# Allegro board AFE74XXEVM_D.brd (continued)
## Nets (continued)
CIN1: C155.2 L12.2 T12.3(PRI DOT)
CIN1M: C147.1 U1.Y16(RXCDSA1M)
CIN1P: C146.1 U1.Y17(RXCDSA1P)
CIN2: C487.2 L59.2 T14.3(PRI DOT)
CIN2M: C491.1 U1.Y13(RXCDSA2M)
CIN2P: C490.1 U1.Y14(RXCDSA2P)
CLK0_M2C_N: C423.2 J32.H5
CLK0_M2C_P: C424.2 J32.H4
CLK1_M2C_N: C425.2 J32.G3
CLK1_M2C_P: C426.2 J32.G2
CLK-IN: R159.1 R161.2 R165.1 T24.6(PRIMARY_DOT)
CLK_LAO_0M: J32.G7 R191.2
CLK_LAO_0P: J32.G6 R189.2
CLK_N: L2.1 R295.1 R323.1 U1.L19(CLKM)
CLK_P: L1.1 R295.2 R322.1 U1.K19(CLKP)
CLKIN1_N: C230.2 C231.2 L43.2
CLKIN1_P: C227.2 L44.2
CLKIN1N: C239.2 L43.1 U3.35(CLKIN1N/FBCLKINN/FINN)
CLKIN1P: C238.2 L44.1 U3.34(CLKIN1P/FBCLKINP/FINP)
CLKINN: C231.1 R166.2 T24.3(SECONDARY)
CLKINP: C227.1 R157.1 R159.2 R166.1 T24.1(SECONDARY_DOT)
CLKLA_0M: R191.1 R192.1 U3.63(DCLKOUT12N)
CLKLA_0P: R189.1 R190.1 U3.62(DCLKOUT12P)
CLKN: C228.2 L2.2
CLKP: C229.2 L1.2
CNTR_TAP_CHA: C187.1 C188.2 C190.1 C191.1 L29.2 T20.5(SECONDARY_CT)
CNTR_TAP_CHB: C193.1 C194.1 C199.1 C200.2 L31.2 T21.5(SECONDARY_CT)
CNTR_TAP_CHC: C206.1 C207.2 C209.1 C210.1 L37.2 T22.5(SECONDARY_CT)
CNTR_TAP_CHD: C212.1 C213.1 C218.1 C219.2 L39.2 T23.5(SECONDARY_CT)
CP1: C222.1 C223.1 R152.2 U3.32(CPOUT1) Y1.1(VC)
CP2: C225.1 C226.1 U3.46(CPOUT2)
D_IN1: J20.1(CENTER) R115.1 R118.2
D_IN2: J21.1(CENTER) R345.2 R347.1
DAC_ALT_SYNC_N: J32.F20 U1.P10(SYNCBOUTM1)
DAC_ALT_SYNC_P: J32.F19 U1.P11(SYNCBOUTP1)
DAC_SYNC_N: J32.F11 U1.G10(SYNCBOUTM0)
DAC_SYNC_P: J32.F10 U1.G11(SYNCBOUTP0)
DACCLK_IN: C4.1 J1.1(CENTER)
DACOUT: R21.2 R321.2
DCLKOUT4N: C254.1 R188.1 U3.25(DCLKOUT4N)
DCLKOUT4P: C253.1 R187.1 U3.24(DCLKOUT4P)
DCLKOUT6N: C424.1 R289.1 U3.28(DCLKOUT6N)
DCLKOUT6P: C423.1 R290.1 U3.27(DCLKOUT6P)
DCLKOUT10N: C428.1 R293.1 U3.55(DCLKOUT10N)
DCLKOUT10P: C427.1 R294.1 U3.54(DCLKOUT10P)
DIN1: C148.2 L16.2 T16.3(PRI DOT)
DIN1M: C154.1 U1.Y10(RXDDSA1M)
DIN1P: C153.1 U1.Y11(RXDDSA1P)
DIN2: C495.2 L63.2 T18.3(PRI DOT)
DIN2M: C498.1 U1.Y7(RXDDSA2M)
DIN2P: C499.1 U1.Y8(RXDDSA2P)
DIV_IN: C1.2 U2.2(CLK)
DM: J33.2(D-) R211.1
DP: J33.3(D+) R212.1
DP0_C2M_N: C37.1 J32.C3
DP0_C2M_P: C39.1 J32.C2
DP0_M2C_N: C35.1 J32.C7
DP0_M2C_P: C36.1 J32.C6
DP1_C2M_N: C33.1 J32.A23
DP1_C2M_P: C34.1 J32.A22
DP1_M2C_N: C38.1 J32.A3
DP1_M2C_P: C40.1 J32.A2
DP2_C2M_N: C31.1 J32.A27
DP2_C2M_P: C29.1 J32.A26
DP2_M2C_N: C32.1 J32.A7
DP2_M2C_P: C30.1 J32.A6
DP3_C2M_N: C26.1 J32.A31
DP3_C2M_P: C25.1 J32.A30
DP3_M2C_N: C27.1 J32.A11
DP3_M2C_P: C28.1 J32.A10
DP4_C2M_N: C19.1 J32.A35
DP4_C2M_P: C17.1 J32.A34
DP4_M2C_N: C20.1 J32.A15
DP4_M2C_P: C18.1 J32.A14
DP5_C2M_N: C10.1 J32.A39
DP5_C2M_P: C9.1 J32.A38
DP5_M2C_N: C13.1 J32.A19
DP5_M2C_P: C14.1 J32.A18
DP6_C2M_N: C11.1 J32.B37
DP6_C2M_P: C12.1 J32.B36
DP6_M2C_N: C15.1 J32.B17
DP6_M2C_P: C16.1 J32.B16
DP7_C2M_N: C23.1 J32.B33
DP7_C2M_P: C21.1 J32.B32
DP7_M2C_N: C24.1 J32.B13
DP7_M2C_P: C22.1 J32.B12
EE_ADDR0_RX: J32.C34 U31.1(A0)
EE_ADDR1_RX: J32.D35 U31.2(A1)
EEDATA: R220.1 U5.61(EEDATA) U8.3(DI)
FBBANDSEL1: J9.50 U1.H9(FBBANDSEL1)
FBBANDSEL2: J9.53 U1.N9(FBBANDSEL2)
FMC_FBBANDSEL1: J9.51
FMC_FBBANDSEL2: J9.54
FMC_FSPICLKA: J32.J6 R40.2
FMC_FSPICLKB: J32.J7 R42.2
FMC_FSPICLKC: J32.J9 R44.2
FMC_FSPICLKD: J32.J10 R46.2
FMC_FSPIDA: J32.J12 R41.2
FMC_FSPIDB: J32.J13 R43.2
FMC_FSPIDC: J32.J15 R45.2
FMC_FSPIDD: J32.J16 R47.2
FMC_LMK_CS: J32.H17 U33.5(A4)
FMC_LMK_SCK: J32.G15 U33.2(A1)
FMC_LMK_SDIO: J32.G16 U33.3(A2)
FMC_LMK_SDO: J32.H16 U33.4(A3)
FMC_RXADSA1PD: J7.9 J32.K7
FMC_RXADSA2PD: J7.12 J32.K8
FMC_RXADSAFAST: J9.3 J32.G18
FMC_RXAPD2H: J7.33 J32.K10
FMC_RXAPD2L: J7.36 J32.K11
FMC_RXBDSA1PD: J7.15 J32.K13
FMC_RXBDSA2PD: J7.18 J32.K14
FMC_RXBDSAFAST: J9.6 J32.G21
FMC_RXBPD2H: J7.39 J32.J18
FMC_RXBPD2L: J7.42 J32.J19
FMC_RXCDSA1PD: J7.21
FMC_RXCDSA2PD: J7.24
FMC_RXCDSAFAST: J9.9
FMC_RXDDSA1PD: J7.27
FMC_RXDDSA2PD: J7.30
FMC_RXDDSAFAST: J9.12
FMC_RXDSASW: J9.48 J32.F13
FMC_RXFBNCO0: J9.15
FMC_RXFBNCO1: J9.18
FMC_RXFBNCO2: J9.21
FMC_RXFBNCO3: J9.24
FMC_RXFBSW1: J9.39
FMC_RXFBSW2: J9.42
FMC_RXTDD1: J9.33
FMC_RXTDD2: J9.36
FMC_SCL: J32.C30 J37.2 U31.6(SCL)
FMC_SDA: J32.C31 J37.1 U31.5(SDA)
FMC_SPIACLK: J13.6 J32.D11
FMC_SPIASDIO: J13.12 J32.D12
FMC_SPIASDO: J13.9 J32.D26
FMC_SPIASEN: J13.3 J32.D27
FMC_SPIBCLK: J13.18 J32.E12
FMC_SPIBSDIO: J13.24 J32.E13
FMC_SPIBSDO: J13.21 J32.E15
FMC_SPIBSEN: J13.15 J32.E16
FMC_TCK: J10.3 J32.D29
FMC_TDI: J10.6 J32.D30
FMC_TDO: J10.9 J32.D31
FMC_TMS: J10.12 J32.D33
FMC_TRSTB: J10.15 J32.D34
FMC_TXDSASW: J9.45 J32.F14
FMC_TXTDD1: J9.27 J32.F16
FMC_TXTDD2: J9.30 J32.F17
FPGA_CLK1_N: C241.2 J32.K5
FPGA_CLK1_P: C240.2 J32.K4
FPGA_CLK1N: C241.1 R177.1 U3.52(DCLKOUT8N)
FPGA_CLK1P: C240.1 R176.1 U3.51(DCLKOUT8P)
FPGA_CLK2_N: C250.2 J32.J3
FPGA_CLK2_P: C249.2 J32.J2
FPGA_CLK2N: C250.1 R182.1 U3.50(SDCLKOUT9N)
FPGA_CLK2P: C249.1 R183.1 U3.49(SDCLKOUT9P)
FSPICLKA: R33.2 R40.1 U1.C11(FSPICLKA)
FSPICLKB: R35.2 R42.1 U1.C14(FSPICLKB)
FSPICLKC: R36.2 R44.1 U1.V11(FSPICLKC)
FSPICLKD: R39.2 R46.1 U1.V14(FSPICLKD)
FSPIDA: R32.2 R41.1 U1.C10(FSPIDA)
FSPIDB: R34.2 R43.1 U1.C13(FSPIDB)
FSPIDC: R37.2 R45.1 U1.V10(FSPIDC)
FSPIDD: R38.2 R47.1 U1.V13(FSPIDD)
FTDI_DSASW: C45.2 J9.43 J9.46 JP7.1 R24.1 U10.4(A3)
FTDI_FBBANDSEL: C46.2 J9.49 J9.52 JP8.1 R25.1 U10.5(A4)
FTDI_FSPICLKA: J12.2 U6.1(A1)
FTDI_FSPICLKB: J12.6 U6.4(A3)
FTDI_FSPICLKC: J12.10 U6.6(A5)
FTDI_FSPICLKD: J12.14 U6.8(A7)
FTDI_FSPIDA: J12.4 U6.3(A2)
FTDI_FSPIDB: J12.8 U6.5(A4)
FTDI_FSPIDC: J12.12 U6.7(A6)
FTDI_FSPIDD: J12.16 U6.9(A8)
FTDI_RXDSAFAST: C42.2 J9.1 J9.4 J9.7 J9.10 JP2.1 R27.1 U10.2(A1)
FTDI_RXFBNCO: C47.2 J9.13 J9.16 J9.19 J9.22 JP3.1 R28.1 U10.3(A2)
FTDI_RXFBSW: C44.2 J9.37 J9.40 JP6.1 R23.1 U9.9(A8)
FTDI_RXTDD_MODE: C43.2 J9.31 J9.34 JP5.1 R22.1 U9.8(A7)
FTDI_SPIACLK: J13.4 U7.3(A2)
FTDI_SPIASDIO: J13.10 U7.5(A4)
FTDI_SPIASDO: J13.7 U7.4(A3)
FTDI_SPIASEN: J13.1 U7.1(A1)
FTDI_SPIBCLK: J13.16 U7.7(A6)
FTDI_SPIBSDIO: J13.22 U7.9(A8)
FTDI_SPIBSDO: J13.19 U7.8(A7)
FTDI_SPIBSEN: J13.13 U7.6(A5)
FTDI_TCK: J10.1 U9.1(A1)
FTDI_TDI: J10.4 U9.3(A2)
FTDI_TDO: J10.7 U9.4(A3)
FTDI_TMS: J10.10 U9.5(A4)
FTDI_TRSTB: J10.13 U9.6(A5)
FTDI_TXTDD_MODE: C48.2 J9.25 J9.28 JP4.1 R29.1 U9.7(A6)
GBTCLK1_M2C_N: C428.2 J32.B21
GBTCLK1_M2C_P: C427.2 J32.B20
GTX_CLKM: C224.2 J32.D5
GTX_CLKP: C221.2 J32.D4
GTXCLKM: C224.1 R154.1 U3.2(DCLKOUT0N)
GTXCLKP: C221.1 R155.1 U3.1(DCLKOUT0P)
IOUTA: J22.1(CENTER) R136.1 R139.1
IOUTB: J23.1(CENTER) R140.1 R143.1
IOUTC: J24.1(CENTER) R144.1 R147.1
IOUTD: J25.1(CENTER) R148.1 R151.1
LMK LOCKED: D6.1(ANODE) R199.1
LMK_CLKIN: J26.1(CENTER) R161.1 R164.1
LMK_CS: J36.11 U3.18(\\C\S\)
LMK_SCK: J36.2 U3.19(SCK)
LMK_SDIO: J36.5 U3.20(SDIO)
LMK_SDO: J36.8 R195.2 U3.5(RESET)
NB7_RESET: R205.2 U2.15(R)
OSCI: C296.1 U5.2(OSCI) Y2.1
OSCINN: C252.2 C255.2 U3.44(OSCINN)
OSCINP: C245.2 C247.2 U3.43(OSCINP)
OSCO: C298.1 U5.3(OSCO) Y2.3
OSCP: C244.2 C245.1 R175.2 R180.1
PG_2P2V: Q27.1(B) R273.2 R328.1 U18.5(PG)
PG_C2M: J32.D1 R287.1
PG_DVDD1P0V: R251.2 R326.1 U16.22(PG) U27.4(PG)
PG_M2C: J32.F1 R286.2
PG_RX1P2V: R257.2 R279.2 R325.1 U23.4(PG)
PG_RX1P85V: Q25.2(G1) R327.2 U25.4(PG)
PG_TX1P0V: R261.2 R324.1 U20.4(PG)
PG_TX1P8V: R267.2 R308.2 U22.4(PG) U29.4(PG)
PLL2 LOCKED: D7.1(ANODE) R200.1
PLL_CLKLD: J8.3 Q2.1(B)
PLL_REFLD: J8.1 Q1.1(B)
PLLCLKLD: J8.4 U1.T16(PLLCLKLD)
PLLREFLD: J8.2 U1.E16(PLLREFLD)
PRESENT: J32.H2 R288.1
RX1N: C9.2 U1.A2(SRX1M)
RX1P: C10.2 U1.A3(SRX1P)
RX2N: C12.2 U1.C1(SRX2M)
RX2P: C11.2 U1.B1(SRX2P)
RX3N: C17.2 U1.F1(SRX3M)
RX3P: C19.2 U1.E1(SRX3P)
RX4N: C21.2 U1.J1(SRX4M)
RX4P: C23.2 U1.H1(SRX4P)
RX5N: C26.2 U1.M1(SRX5M)
RX5P: C25.2 U1.N1(SRX5P)
RX6N: C31.2 U1.R1(SRX6M)
RX6P: C29.2 U1.T1(SRX6P)
RX7N: C33.2 U1.V1(SRX7M)
RX7P: C34.2 U1.W1(SRX7P)
RX8N: C37.2 U1.Y2(SRX8M)
RX8P: C39.2 U1.Y3(SRX8P)
RX_1.2V: C81.1 C82.1 C83.1 C84.1 C85.1 C86.1 C87.1 C88.1 C89.1 C90.1 C388.1 C389.1 FB32.3 PP20.1 U1.F5(RX1P2V#F5) U1.F6(RX1P2V#F6) U1.F7(RX1P2V#F7) U1.F8(RX1P2V#F8) U1.F9(RX1P2V#F9) U1.F10(RX1P2V#F10) U1.G6(RX1P2V#G6) U1.G7(RX1P2V#G7) U1.G8(RX1P2V#G8) U1.P6(RX1P2V#P6) U1.P7(RX1P2V#P7) U1.P8(RX1P2V#P8) U1.R5(RX1P2V#R5) U1.R6(RX1P2V#R6) U1.R7(RX1P2V#R7) U1.R8(RX1P2V#R8) U1.R9(RX1P2V#R9) U1.R10(RX1P2V#R10)
RX_1.8V: C66.1 C67.1 C68.1 C69.1 C70.1 C71.1 C72.1 C73.1 C74.1 C75.1 C394.1 C395.1 FB33.3 PP22.1 U1.C5(RX1P8V#C5) U1.C6(RX1P8V#C6) U1.D5(RX1P8V#D5) U1.D6(RX1P8V#D6) U1.D9(RX1P8V#D9) U1.D10(RX1P8V#D10) U1.E5(RX1P8V#E5) U1.E6(RX1P8V#E6) U1.E9(RX1P8V#E9) U1.E10(RX1P8V#E10) U1.T5(RX1P8V#T5) U1.T6(RX1P8V#T6) U1.T9(RX1P8V#T9) U1.T10(RX1P8V#T10) U1.U5(RX1P8V#U5) U1.U6(RX1P8V#U6) U1.U9(RX1P8V#U9) U1.U10(RX1P8V#U10) U1.V5(RX1P8V#V5) U1.V6(RX1P8V#V6)
RXA_DSA1PD: J7.7 Q5.1(B)
RXA_DSA2PD: J7.10 Q6.1(B)
RXA_PD2H: J7.31 Q13.1(B)
RXA_PD2L: J7.34 Q14.1(B)
RXADSA1PD: J7.8 R302.1
RXADSA2PD: J7.11 R303.1
RXADSAFAST: J9.2 U1.E14(RXADSAFAST)
RXAPD2H: J7.32 R315.1
RXAPD2L: J7.35 R316.1
RXB_DSA1PD: J7.13 Q7.1(B)
RXB_DSA2PD: J7.16 Q8.1(B)
RXB_PD2H: J7.37 Q15.1(B)
RXB_PD2L: J7.40 Q16.1(B)
RXBDSA1PD: J7.14 R309.1
RXBDSA2PD: J7.17 R310.1
RXBDSAFAST: J9.5 U1.F11(RXBDSAFAST)
RXBPD2H: J7.38 R317.1
RXBPD2L: J7.41 R318.1
RXC_DSA1PD: J7.19 Q9.1(B)
RXC_DSA2PD: J7.22 Q10.1(B)
RXC_PD2H: J7.43 Q17.1(B)
RXC_PD2L: J7.46 Q18.1(B)
RXCDSA1PD: J7.20 R311.1
RXCDSA2PD: J7.23 R312.1
RXCDSAFAST: J9.8 U1.T14(RXCDSAFAST)
RXCPD2H: J7.44 R319.1
RXCPD2L: J7.47 R320.1
RXD_DSA1PD: J7.25 Q11.1(B)
RXD_DSA2PD: J7.28 Q12.1(B)
RXD_PD2H: J7.49 Q19.1(B)
RXD_PD2L: J7.52 Q20.1(B)
RXDDSA1PD: J7.26 R313.1
RXDDSA2PD: J7.29 R314.1
RXDDSAFAST: J9.11 U1.R11(RXDDSAFAST)
RXDPD2H: J7.50 R304.1
RXDPD2L: J7.53 R305.1
RXDSASW: J9.47 U1.D13(RXDSASW)
RXFBNCO0: J9.14 U1.C12(RXFBNCO0)
RXFBNCO1: J9.17 U1.G9(RXFBNCO1)
RXFBNCO2: J9.20 U1.V12(RXFBNCO2)
RXFBNCO3: J9.23 U1.P9(RXFBNCO3)
RXFBSW1: J9.38 U1.E11(RXFBSW1)
RXFBSW2: J9.41 U1.T11(RXFBSW2)
RXTDD1: J9.32 U1.D7(RXTDD1)
RXTDD2: J9.35 U1.U7(RXTDD2)
SDCLKOUT5N: C257.1 R194.1 U3.23(SDCLKOUT5N)
SDCLKOUT5P: C256.1 R193.1 U3.22(SDCLKOUT5P)
SDCLKOUT7N: C426.1 R291.1 U3.30(SDCLKOUT7N)
SDCLKOUT7P: C425.1 R292.1 U3.29(SDCLKOUT7P)
SLEEPMODE: J9.62 U1.P5(SLEEPMODE)
SPIACLK: J13.5 U1.D14(SPIACLK)
SPIASDIO: J13.11 U1.E15(SPIASDIO)
SPIASDO: J13.8 U1.C15(SPIASDO)
SPIASEN: J13.2 U1.D15(SPIASEN)
SPIBCLK: J13.17 U1.U14(SPIBCLK)
SPIBSDIO: J13.23 U1.T15(SPIBSDIO)
SPIBSDO: J13.20 U1.V15(SPIBSDO)
SPIBSEN: J13.14 U1.U15(SPIBSEN)
STAT 0: D4.1(ANODE) R197.1
STAT 1: D5.1(ANODE) R198.1
SYNC: R196.2 U3.6(SYNC)
SYNCB0CMOS: J32.E6 U1.E13(SYNCB0CMOS)
SYNCB1CMOS: J32.E7 U1.C8(SYNCB1CMOS)
SYNCB2CMOS: J32.E9 U1.T13(SYNCB2CMOS)
SYNCB3CMOS: J32.E10 U1.V8(SYNCB3CMOS)
SYSREF+: R172.1 R174.1 U3.14(SDCLKOUT3N)
SYSREF-: R169.1 R173.1 U3.13(SDCLKOUT3P)
SYSREF-N: R13.2 R14.1 R296.1 U1.L14(SYSREFM)
SYSREF-P: R11.1 R12.2 R296.2 U1.K14(SYSREFP)
SYSREFN: R13.1 R15.2 R169.2
SYSREFP: R12.1 R16.2 R172.2
TCLK: J10.2 U1.K5(TCLK)
TDI: J10.5 U1.L5(TDI)
TDO: J10.8 U1.H5(TDO)
TMS: J10.11 U1.N5(TMS)
TRST: J10.14 R30.1 U1.M5(TRST)
TX1ENB: J9.56 U1.D16(TXENB1)
TX1N: C14.2 U1.C3(STX1M)
TX1P: C13.2 U1.C4(STX1P)
TX2ENB: J9.59 U1.U16(TXENB2)
TX2N: C16.2 U1.E3(STX2M)
TX2P: C15.2 U1.E4(STX2P)
TX3N: C18.2 U1.G3(STX3M)
TX3P: C20.2 U1.G4(STX3P)
TX4N: C22.2 U1.J3(STX4M)
TX4P: C24.2 U1.J4(STX4P)
TX5N: C27.2 U1.M3(STX5M)
TX5P: C28.2 U1.M4(STX5P)
TX6N: C32.2 U1.P3(STX6M)
TX6P: C30.2 U1.P4(STX6P)
TX7N: C35.2 U1.T3(STX7M)
TX7P: C36.2 U1.T4(STX7P)
TX8N: C38.2 U1.V3(STX8M)
TX8P: C40.2 U1.V4(STX8P)
TXAM: L27.1 R137.2 T20.4(SECONDARY_DOT) U1.C20(TXAM)
TXAP: L28.2 R137.1 T20.6(SECONDARY) U1.B20(TXAP)
TXBM: L34.2 R141.1 T21.6(SECONDARY) U1.F20(TXBM)
TXBP: L33.1 R141.2 T21.4(SECONDARY_DOT) U1.G20(TXBP)
TXCM: L35.1 R145.2 T22.4(SECONDARY_DOT) U1.W20(TXCP)
TXCP: L36.2 R145.1 T22.6(SECONDARY) U1.V20(TXCM)
TXDM: L42.2 R149.1 T23.6(SECONDARY) U1.P20(TXDP)
TXDP: L41.1 R149.2 T23.4(SECONDARY_DOT) U1.R20(TXDM)
TXDSASW: J9.44 U1.U13(TXDSASW)
TXTDD1: J9.26 U1.C16(TXTDD1)
TXTDD2: J9.29 U1.V16(TXTDD2)
U16_FB: C340.2 R237.2 R239.2 R243.1 R245.2 R321.1 U16.2(FB)
U16_SW: C327.1 L46.1 R236.2 U16.6(SW1) U16.7(SW2) U16.8(SW3) U16.9(SW4) U16.10(SW5) U16.11(SW6)
USB_DM: C291.1 R211.2 U5.7(DM)
USB_DP: C290.1 R212.2 U5.8(DP)
USB_EECLK: R218.1 U5.62(EECLK) U8.2(CLK)
USB_EECS: R217.1 U5.63(EECS) U8.1(CS)
USB_REF: R214.1 U5.6(REF)
USB_RST: R215.2 U5.14(RESET)
VADJ: J32.E39 J32.F40 J32.G39 J32.H40 R286.1
VIO_B_M2C: J32.J39 J32.K40 TP3.1(TP)
VREF_A_M2C: J32.H1 TP4.1(TP)
VREF_B_M2C: J32.K1 TP5.1(TP)
Y2_N: R184.1 R185.1 Y1.4(OUT_N)
Y2_P: R178.1 R179.1 Y1.5(OUT_P)
YO2_N: C251.1 R184.2
YO2_P: C244.1 R178.2
N16791764: J33.1(VBUS) R210.2
N16791900: C282.1 C283.1 FB14.2 FB15.2 U5.4(VPHY)
N16791904: C271.1 C272.1 FB12.2 U5.9(VPLL)
N16792068: R213.2 R215.1 R216.2
N16792392: R219.1 R220.2 U8.4(DO)
N16935212: U5.21(ADBUS4) U6.15(B5)
N16935240: U5.16(ADBUS0) U6.20(B1)
N16935242: U5.18(ADBUS2) U6.17(B3)
N17033323: FB15.1 R209.1
N17033325: D11.1(ANODE) R209.2
N17828171: C280.1 C281.1 FB13.1 U4.5(VOUT)
N17829143: R208.1 U4.3(EN)
N17906763: J31.1(CENTER) R196.1
N18051729: U5.38(CDBUS0) U9.20(B1)
N18051775: U5.39(CDBUS1) U9.18(B2)
N18051825: U5.40(CDBUS2) U9.17(B3)
N18051839: U5.41(CDBUS3) U9.16(B4)
N18199775: C251.2 C252.1 R181.2 R186.1
N18276385: C238.1 R171.2 U2.11(Q)
N18284119: C239.1 R170.2 U2.10(Q\)
N18332593: U2.1(VTCLK) U2.4(V\T\C\L\K\) U2.5(VREFAC)
N18332757: U5.23(ADBUS6) U6.13(B7)
N18476239: JP1.1 Y1.6(VDD)
N18554997: D12.1(ANODE) R221.2
N18555159: Q24.4(G) U12.4(GATE)
N18858492: R3.1 R322.2 T3.4(SEC)
N18858499: C4.2 R4.1 R7.1
N18858501: R10.1 R323.2 T3.6(SEC DOT)
N18864728: Q22.1(B) R204.2
N18864745: J32.C18 R202.1
N18864749: Q23.1(B) R206.2
N18864761: J32.D18 R206.1
N18864763: J32.D17 R204.1
N18864798: Q22.3(C) R203.2
N18864814: Q21.1(B) R202.2
N18865554: D9.2(CATHODE) R203.1
N18865572: D8.2(CATHODE) R201.1
N18865624: D10.2(CATHODE) R207.1
N18865630: J32.H19 R205.1
N18883805: C186.1 C187.2 C189.2 T20.2(PRIMARY)
N18883857: C184.2 R136.2 R138.1
N18883928: C195.2 R140.2 R142.1
N18883944: C198.2 C199.2 C201.2 T21.2(PRIMARY)
N18884373: C184.1 C185.2 T20.3(PRIMARY_DOT)
N18884375: C195.1 C197.2 T21.3(PRIMARY_DOT)
N18885333: C205.2 C206.2 C208.2 T22.2(PRIMARY)
N18885345: C202.2 R144.2 R146.1
N18885353: C214.2 R148.2 R150.1
N18885357: C217.2 C218.2 C220.2 T23.2(PRIMARY)
N18885439: C202.1 C204.2 T22.3(PRIMARY_DOT)
N18885440: C214.1 C216.2 T23.3(PRIMARY_DOT)
N18893180: C133.1 T5.6(PRI DOT)
N18962088: C309.1 C310.1 C311.1 FB17.1 U11.1(OUT1) U11.20(OUT2)
N18962090: C314.1 U11.14(NR)
N18962122: R222.2 U11.12(0P1V)
N18962132: R223.2 U11.11(0P2V)
N18962213: R224.2 U11.10(0P4V)
N18963933: R252.2 U20.5(50MV)
N18963939: C353.1 C355.1 C451.1 RS3.2 U19.3(VIN+) U20.1(OUT1) U20.19(OUT2) U20.20(OUT3)
N18963949: C362.1 U20.12(BIAS)
N18963966: R253.2 U20.6(100MV)
N18963972: C358.1 U20.3(FB)
N18963976: R254.2 U20.7(200MV)
N18964074: PP8.1 R249.1 R250.1
N18964185: R249.2 U19.1(OUT)
N18964329: C361.1 U20.13(NR/SS)
N18992157: R282.2 U29.6(100MV)
N18992183: C415.1 C418.1 C456.1 RS8.2 U29.1(OUT1) U29.19(OUT2) U29.20(OUT3) U30.3(VIN+)
N18992193: C420.1 U29.12(BIAS)
N18992197: R283.2 U29.7(200MV)
N18992199: C419.1 U29.3(FB)
N18992203: R284.2 U29.9(400MV)
N18992243: PP28.1 R280.1 R281.1
N18992297: R280.2 U30.1(OUT)
N18992349: C421.1 U29.13(NR/SS)
N18994871: R285.2 U29.10(800MV)
N19007167: C333.1 C334.1 C335.2 C336.1 L49.2 R234.2 U16.12(VIN1) U16.13(VIN2) U16.14(VIN3) U16.15(VIN4) U16.16(VIN5) U16.17(VIN6)
N19009214: C328.1 R234.1 U16.20(VDD)
N19009493: C501.1 Q26.3(C) U16.21(EN/SS)
N19010016: C327.2 R235.1
N19010394: C337.1 C447.1 C448.1 L46.2 R240.1 RS2.2 U17.3(VIN+)
N19011515: PP6.1 R238.1 R241.1
N19011541: C330.1 C449.1 C450.1 FB19.1 FB20.1 FB38.1 RS2.1 U17.4(VIN-)
N19011602: R238.2 U17.1(OUT)
N19016825: C338.2 R237.1
N19016841: C338.1 R239.1 R240.2 R301.2
N19016961: C342.2 R245.1
N19016975: C340.1 C342.1 U16.1(COMP)
N19024858: C329.2 R236.1
N19030259: R244.1 U16.18(ILIM)
N19030918: C341.1 U16.19(BP)
N19075291: R31.2 U1.V18(RBIAS)
N19075362: C49.1 U1.U18(EXTO)
N19075631: J11.1 U1.M15(ATESTTX)
N19075640: J11.3 U1.H8(VSENSE)
N19075649: J11.5 U1.N8(IFORCE)
N19075658: J11.7 U1.K2(AMUX1)
N19075667: J11.9 U1.L2(AMUX2)
N19080738: C242.2 C243.2 C246.2 C248.2 FB1.1 JP1.2
N19081029: SJP1.2(PIN2) Y1.2(NC)
N19083254: R199.2 U3.31(STATUS_LD1)
N19083268: R200.2 U3.48(STATUS_LD2)
N19083286: R198.2 U3.59(CLKIN_SEL1)
N19083328: R197.2 U3.58(CLKIN_SEL0)
N19083344: C267.1 U3.12(LDOBYP2)
N19083346: C268.1 U3.11(LDOBYP1)
N19083364: C258.2 C259.2 C260.2 FB2.2 U3.10(VCC1_VCO) U3.33(VCC5_DIG) U3.36(VCC6_PLL1)
N19083444: FB7.2 U3.39(VCC7_OSCOUT)
N19083446: FB9.2 U3.45(VCC9_CP2)
N19083508: C264.2 C265.2 C266.2 FB6.2 FB7.1 FB8.1 FB9.1 U3.47(VCC10_PLL2)
N19083566: C262.2 FB3.2 U3.21(VCC3_SYSREF)
N19083568: C261.2 FB5.2 U3.17(VCC2_CG1)
N19083616: C270.2 FB11.2 U3.64(VCC12_CG0)
N19083618: C269.2 FB10.2 U3.53(VCC11_CG3)
N19083707: C263.2 FB4.2 U3.26(VCC4_CG2)
N19086842: C229.1 R168.1 U3.16(DCLKOUT2N)
N19086844: C228.1 R167.1 U3.15(DCLKOUT2P)
N19098122: C127.2 C129.2 L3.2
N19098132: C130.2 C133.2 L3.1
N19098142: C130.1 L5.1 R58.2
N19098149: C129.1 L5.2 R48.2
N19098687: C131.2 R48.1
N19098701: C136.2 R58.1
N19189047: C253.2 J27.1(CENTER)
N19189049: C254.2 J28.1(CENTER)
N19191731: R4.2 T2.2(PRI DOT)
N19192217: C7.1 R8.2 R9.1
N19192242: C7.2 T3.2(PRI DOT)
N19192342: R8.1 T2.4(SEC)
N19192872: C1.1 R1.2 R2.1
N19192989: R1.1 T2.6(SEC DOT)
N19193468: C41.1 R17.2 SW1.2 U1.C18(RESETZ)
N19234861: FB8.2 U3.42(VCC8_OSCIN)
N19245147: C132.1 L6.2 R52.2 R54.2
N19261159: J2.1(CENTER) R3.2
N19261175: J4.1(CENTER) R10.2
N19261803: J5.1(CENTER) R11.2
N19261938: J6.1(CENTER) R14.2
N19265268: R302.2 U1.E8(RXADSA1PD)
N19265271: R303.2 U1.C9(RXADSA2PD)
N19265297: R309.2 U1.E12(RXBDSA1PD)
N19265300: R310.2 U1.D12(RXBDSA2PD)
N19265317: R311.2 U1.T8(RXCDSA1PD)
N19265320: R312.2 U1.V9(RXCDSA2PD)
N19265379: R313.2 U1.T12(RXDDSA1PD)
N19265382: R314.2 U1.U12(RXDDSA2PD)
N19265545: R315.2 U1.D8(RXAPD2H)
N19265548: R316.2 U1.D11(RXAPD2L)
N19265574: R317.2 U1.C7(RXBPD2H)
N19265577: R318.2 U1.E7(RXBPD2L)
N19265594: R319.2 U1.U8(RXCPD2H)
N19265597: R320.2 U1.U11(RXCPD2L)
N19265616: R304.2 U1.V7(RXDPD2H)
N19265619: R305.2 U1.T7(RXDPD2L)
N19270100: C256.2 J29.1(CENTER)
N19270102: C257.2 J30.1(CENTER)
N19353777: C127.1 T5.4(PRI)
N19392140: C6.2 T1.6(SECONDARY_DOT)
N19392142: C6.1 R5.1 U1.L15(CLKOUTM)
N19392187: C2.1 R5.2 U1.K15(CLKOUTP)
N19392195: C3.1 T1.3(PRIMARY_DOT)
N19392206: C3.2 J3.1(CENTER) R6.2
N19393571: R21.1 U1.G5(DACOUT)
N19402254: J36.10 U5.54(DDBUS3)
N19402263: J36.7 U5.53(DDBUS2)
N19402272: J36.4 U5.52(DDBUS1)
N19402281: J36.1 U5.48(DDBUS0)
N19403607: U5.17(ADBUS1) U6.18(B2)
N19403614: U5.19(ADBUS3) U6.16(B4)
N19403621: U5.22(ADBUS5) U6.14(B6)
N19403628: U5.24(ADBUS7) U6.12(B8)
N19407936: U5.43(CDBUS4) U9.15(B5)
N19409548: U5.26(BDBUS0) U7.20(B1)
N19409557: U5.27(BDBUS1) U7.18(B2)
N19409566: U5.28(BDBUS2) U7.17(B3)
N19409575: U5.29(BDBUS3) U7.16(B4)
N19410556: U5.30(BDBUS4) U7.15(B5)
N19410565: U5.32(BDBUS5) U7.14(B6)
N19410574: U5.33(BDBUS6) U7.13(B7)
N19410583: U5.34(BDBUS7) U7.12(B8)
N19439857: J12.1 R33.1
N19439882: J12.3 R32.1
N19439919: J12.5 R35.1
N19439930: J12.7 R34.1
N19439963: J12.9 R36.1
N19439974: J12.11 R37.1
N19440007: J12.13 R39.1
N19440018: J12.15 R38.1
N19452593: Q1.3(C) R18.2
N19452616: D1.2(CATHODE) R18.1
N19452717: Q2.3(C) R19.2
N19452732: D2.2(CATHODE) R19.1
N19463241: R251.1 U20.14(EN)
N19466012: R279.1 U29.14(EN)
N19467594: R20.1 U1.J5(SCANEN)
N19500229: Q3.3(C) Q4.3(C) Q5.3(C) Q6.3(C) Q7.3(C) Q8.3(C) Q9.3(C) Q10.3(C) Q11.3(C) Q12.3(C) Q13.3(C) Q14.3(C) Q15.3(C) Q16.3(C) Q17.3(C) Q18.3(C) Q19.3(C) Q20.3(C) R26.2
N19509945: D3.2(CATHODE) R26.1
N19512252: U5.44(CDBUS5) U9.14(B6)
N19512261: U5.45(CDBUS6) U9.13(B7)
N19512270: U5.46(CDBUS7) U9.12(B8)
N19520191: U5.55(DDBUS4) U10.10(B4)
N19520200: U5.57(DDBUS5) U10.11(B3)
N19525330: U5.59(DDBUS7) U10.13(B1)
N19525339: U5.58(DDBUS6) U10.12(B2)
N19667706: D14.1(ANODE) R287.2
N19816997: C2.2 T1.4(SECONDARY)
N19898860: J36.3 U33.13(B1)
N19898869: J36.6 U33.12(B2)
N19898878: J36.9 U33.11(B3)
N19898887: J36.12 U33.10(B4)
N20069404: Q25.3(D2) Q25.D2(DRAIN2) R307.1 U13.3(EN)
N20069410: L45.1 U13.7(SW)
N20069434: R228.1 R233.2 U13.5(FB)
N20069572: FB18.1 RS1.1 U15.3(VIN+)
N20069690: Q25.5(G2) Q25.6(D1) Q25.D1(DRAIN1) R306.1
N20069712: PP3.1 R229.1 R232.1
N20069759: R229.2 U15.1(OUT)
N20070471: C435.1 C436.1 C437.1 FB37.1 U32.1(OUT1) U32.20(OUT2)
N20070473: C432.1 U32.14(NR)
N20070515: R298.2 U32.12(0P1V)
N20070523: R299.2 U32.11(0P2V)
N20070610: R297.2 U32.10(0P4V)
N20070750: R300.2 U32.9(0P8V)
N20073169: L48.1 U18.10(SW2)
N20073179: L47.1 U18.2(SW1)
N20073199: R247.2 R248.1 U18.14(FB)
N20073285: R246.1 U18.4(EN)
N20073325: C347.1 U18.12(SS/TR)
N20074418: R277.2 U27.5(50MV)
N20074438: C406.1 C407.1 C455.1 RS7.2 U27.1(OUT1) U27.19(OUT2) U27.20(OUT3) U28.3(VIN+)
N20074448: C412.1 U27.12(BIAS)
N20074452: R276.2 U27.6(100MV)
N20074454: C408.1 U27.3(FB)
N20074458: R278.2 U27.7(200MV)
N20074494: PP25.1 R274.1 R275.1
N20074551: R274.2 U28.1(OUT)
N20074589: C409.1 U27.13(NR/SS)
N20074804: R273.1 U27.14(EN)
N20081535: R258.2 U22.6(100MV)
N20081541: C373.1 C374.1 C452.1 RS4.2 U21.3(VIN+) U22.1(OUT1) U22.19(OUT2) U22.20(OUT3)
N20081551: C380.1 U22.12(BIAS)
N20081555: R259.2 U22.7(200MV)
N20081559: C377.1 U22.3(FB)
N20081574: R260.2 U22.10(800MV)
N20081656: PP16.1 R255.1 R256.1
N20081707: R255.2 U21.1(OUT)
N20081783: C381.1 U22.13(NR/SS)
N20082233: R257.1 U22.14(EN)
N20086063: R270.2 U25.6(100MV)
N20086075: C397.1 C398.1 C454.1 RS6.2 U25.1(OUT1) U25.19(OUT2) U25.20(OUT3) U26.3(VIN+)
N20086085: C401.1 U25.12(BIAS)
N20086089: R271.2 U25.7(200MV)
N20086091: C399.1 U25.3(FB)
N20086095: R272.2 U25.10(800MV)
N20086131: PP23.1 R268.1 R269.1
N20086161: R268.2 U26.1(OUT)
N20086199: C400.1 U25.13(NR/SS)
N20086237: R267.1 U25.14(EN)
N20090664: R261.1 U23.14(EN)
N20090676: C386.1 C387.1 C453.1 RS5.2 U23.1(OUT1) U23.19(OUT2) U23.20(OUT3) U24.3(VIN+)
N20090711: R263.2 U23.5(50MV)
N20090727: C391.1 U23.12(BIAS)
N20090731: R265.2 U23.6(100MV)
N20090737: C390.1 U23.3(FB)
N20090741: R266.2 U23.9(400MV)
N20090777: PP21.1 R262.1 R264.1
N20090807: R262.2 U24.1(OUT)
N20090845: C392.1 U23.13(NR/SS)
N20133985: T4.5(SEC) T5.1(SEC DOT)
N20133989: T4.4(SEC_DOT) T5.3(SEC)
N20135778: C135.2 T5.2(NC)
N20136307: C141.1 T9.4(PRI)
N20136325: C141.2 C142.2 L9.2
N20136327: C140.2 C143.2 L9.1
N20136329: C143.1 L10.1 R77.2
N20136331: C142.1 L10.2 R73.2
N20136361: T8.5(SEC) T9.1(SEC DOT)
N20136363: T8.4(SEC_DOT) T9.3(SEC)
N20136391: C144.2 R73.1
N20136393: C145.2 R77.1
N20136405: C137.1 L4.2 R74.2 R76.2
N20136526: C140.1 T9.6(PRI DOT)
N20136572: C139.2 T9.2(NC)
N20138109: C157.1 T13.6(PRI DOT)
N20138119: C157.2 C159.2 L13.2
N20138121: C158.2 C160.2 L13.1
N20138123: C160.1 L14.1 R97.2
N20138125: C159.1 L14.2 R95.2
N20138185: C146.2 R95.1
N20138187: C147.2 R97.1
N20138199: C155.1 L11.2 R93.2 R94.2
N20138318: C158.1 T13.4(PRI)
N20138362: C161.2 T13.2(NC)
N20138813: C149.1 T17.6(PRI DOT)
N20138823: C149.2 C151.2 L17.2
N20138825: C150.2 C152.2 L17.1
N20138827: C152.1 L18.1 R116.2
N20138829: C151.1 L18.2 R114.2
N20138855: T16.5(SEC) T17.1(SEC DOT)
N20138857: T16.4(SEC_DOT) T17.3(SEC)
N20138889: C153.2 R114.1
N20138891: C154.2 R116.1
N20138903: C148.1 L15.2 R115.2 R119.2
N20139022: C150.1 T17.4(PRI)
N20148716: T12.4(SEC_DOT) T13.3(SEC)
N20186999: T12.5(SEC) T13.1(SEC DOT)
N20188389: C156.2 T17.2(NC)
N20203110: Q26.1(B) Q27.3(C) R329.2
N20221008: C469.1 T7.4(PRI)
N20221026: C469.2 C472.2 L52.2
N20221028: C470.2 C473.2 L52.1
N20221030: C473.1 L53.1 R334.2
N20221032: C472.1 L53.2 R333.2
N20221062: T6.5(SEC) T7.1(SEC DOT)
N20221064: T6.4(SEC_DOT) T7.3(SEC)
N20221092: C474.2 R333.1
N20221094: C475.2 R334.1
N20221106: C471.1 L50.2 R331.2 R332.2
N20221227: C470.1 T7.6(PRI DOT)
N20221265: C476.2 T7.2(NC)
N20221700: T10.5(SEC) T11.1(SEC DOT)
N20221704: C477.1 T11.4(PRI)
N20221714: C477.2 C480.2 L56.2
N20221716: C478.2 C481.2 L56.1
N20221718: C481.1 L57.1 R339.2
N20221720: C480.1 L57.2 R338.2
N20221748: T10.4(SEC_DOT) T11.3(SEC)
N20221780: C482.2 R338.1
N20221782: C483.2 R339.1
N20221794: C479.1 L54.2 R336.2 R337.2
N20221915: C478.1 T11.6(PRI DOT)
N20221947: C484.2 T11.2(NC)
N20222985: T14.5(SEC) T15.1(SEC DOT)
N20222995: T14.4(SEC_DOT) T15.3(SEC)
N20223001: C485.1 T15.6(PRI DOT)
N20223005: C485.2 C488.2 L60.2
N20223007: C486.2 C489.2 L60.1
N20223009: C489.1 L61.1 R344.2
N20223011: C488.1 L61.2 R343.2
N20223065: C490.2 R343.1
N20223067: C491.2 R344.1
N20223080: C487.1 L58.2 R341.2 R342.2
N20223194: C486.1 T15.4(PRI)
N20223236: C492.2 T15.2(NC)
N20223673: T18.5(SEC) T19.1(SEC DOT)
N20223681: C500.2 T19.2(NC)
N20223685: C493.1 T19.6(PRI DOT)
N20223687: C493.2 C496.2 L64.2
N20223689: C494.2 C497.2 L64.1
N20223691: C497.1 L65.1 R349.2
N20223693: C496.1 L65.2 R348.2
N20223728: T18.4(SEC_DOT) T19.3(SEC)
N20223751: C499.2 R348.1
N20223753: C498.2 R349.1
N20223766: C495.1 L62.2 R346.2 R347.2
N20223882: C494.1 T19.4(PRI)
N20382523: JP9.2(PIN2) U32.13(EN)
N176074941: C225.2 R160.1
N176076570: C222.2 R153.1
N188647412: Q23.3(C) R207.2
N188648232: Q21.3(C) R201.2

Pads without a net: J7 3 6 45 48 51 54; J32 B1 B4 B5 B8 B9 B24 B25 B28 B29 B40 C10 C11 C14 C15 C19 C22 C23 C26 C27 D8 D9 D14 D15 D20 D21 D23 D24 E2 E3 E18 E19 E21 E22 E24 E25 E27 E28 E30 E31 E33 E34 E36 E37 F2 F4 F5 F7 F8 F22 F23 F25 F26 F28 F29 F31 F32 F34 F35 F37 F38 G19 G22 G24 G25 G27 G28 G30 G31 G33 G34 G36 G37 H7 H8 H10 H11 H13 H14 H20 H22 H23 H25 H26 H28 H29 H34 H35 H37 H38 J21 J22 J24 J25 J27 J28 J30 J31 J33 J34 J36 J37 K16 K17 K19 K20 K22 K23 K25 K26 K28 K29 K31 K32 K34 K35 K37 K38; J33 4; T1 5; T4 6; T6 6; T8 6; T10 6; T12 6; T14 6; T16 6; T18 6; T20 1; T21 1; T22 1; T23 1; U2 3; U3 7 8 9 37 38 40 41 56 57 60 61; U4 4; U5 36 60; U8 7; U10 6 9; U11 2 4 5 6 9 17 18 19; U12 1 3; U13 8; U18 7 15; U20 9 10 11; U22 5 9 11; U23 7 10 11; U25 5 9 11; U27 9 10 11; U29 5 11; U31 7; U32 2 4 5 6 8 17 18 19; U33 6 9

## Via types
v1: diameter 0.457, hole 0.203, TOP to BOTTOM, 5398 vias
v2: diameter 0.559, hole 0.305, TOP to BOTTOM, 995 vias
v3: diameter 0.305, hole 0.152, TOP to BOTTOM, 242 vias
v4: diameter 0.406, hole 0.203, TOP to BOTTOM, 25 vias
v5: diameter 0.508, hole 0.254, TOP to BOTTOM, 417 vias
v6: diameter 0.762, hole 0.381, TOP to BOTTOM, 72 vias

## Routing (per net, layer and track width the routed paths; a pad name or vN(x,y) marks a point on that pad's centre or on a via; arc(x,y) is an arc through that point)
1.8V_USB: length 6.3
  TOP w0.305: U6.10 181.9,115.99 v1(181.61,115.7) ; v3(190.45,109.52) 190.48,109.5 U5.12 v1(192.07,109.5) ; U9.2 173.15,104.32 v1(173.15,104.32) ; v1(176.96,95.55) 176.95,95.56 v3(176.95,97.1) ; v1(173.28,111.33) 173.28,111.33 U7.2
  BOTTOM w0.305: v3(189.81,109.52) 190.04,109.3 C273.2 190.17,109.25 v3(190.45,109.52)
  BOTTOM w0.508: v1(174.12,107.09) 174.37,107.34 C293.2 ; v1(181.61,115.7) 182.02,116.1 v1(182.17,116.1) ; v1(174.03,100.36) 174.04,100.36 C295.2
  vias: v1(173.02,91.97) v1(173.05,90.8) v1(174.5,107.49) v1(181.05,120.14) v1(181.11,108.73) v1(181.13,107.87) v1(181.15,102.77) v1(182.25,108.73) v1(182.28,107.87) v1(182.93,98.07) v1(183.39,108.73) v1(183.39,107.84) v1(184.54,108.73) v1(184.54,107.87) v1(188.77,104.04) v3(176.94,96.42) v3(176.97,97.75) v3(178.59,109.5) v3(178.92,93.6) v3(178.91,93) v3(178.92,92.23) v3(179.44,109.5) v3(180.29,109.5) v3(181.31,102.12) v3(181.31,101.32) v3(182.83,99.31) v3(182.83,98.68) v3(188.82,102.97) v3(188.81,102.12) v3(188.8,101.27)
3.3V_USB: length 3.8
  TOP w0.305: U9.19 176.4,104.27 v1(176.63,104.5) ; U5.20 187.31,111.77 v1(187.33,111.76) ; U6.19 184.28,120.14 v1(184.33,120.19) ; v3(173.05,97.1) v3(173.05,96.47) v1(173.05,95.61)
  BOTTOM w0.305: v1(176.63,104.5) 176.53,104.39 176.53,104.34
  vias: v1(176.66,111.3) v1(181.66,103.91) v1(182.8,93.5) v1(182.83,92.33) v1(186.46,97.94) v1(186.54,97.54) v1(187.17,95.25) v1(187.17,94.13) v1(187.83,97.54) v1(188.47,95.25) v1(188.47,94.13) v1(189.56,99.59) v1(194.39,104.8) v1(194.52,99.05) v1(194.52,98.08) v1(194.47,97.22) v1(194.64,107.85) v1(195.64,99.05) v1(195.64,98.08) v1(195.59,97.22) v1(196.73,99.05) v1(196.73,98.08) v1(196.68,97.22) v3(173.05,97.76) v3(178.59,106.98) v3(179.44,107) v3(180.22,106.98) v3(181.81,114.05) v3(181.81,113.37) v3(181.81,112.75) v3(181.81,103) v3(181.81,102.12) v3(181.79,101.3) v3(184.81,102.95) v3(184.81,102.13) v3(184.81,101.27)
5.0V_SOURCE: length 24.6
  BOTTOM w0.127: v2(186.35,11.36) 186.35,10.35 v2(186.36,10.34) ; v2(186.35,11.36) 187.34,11.36 v2(187.36,11.34) ; v2(186.35,11.36) 186.33,11.34 v2(185.36,11.34) ; v2(186.35,11.36) 186.36,11.37 v2(186.36,12.34) ; v2(185.36,10.34) v2(184.36,10.34) ; v2(185.36,10.34) v2(185.36,11.34) ; v2(185.36,10.34) v2(186.36,10.34) ; v2(184.36,10.34) 184.45,10.24 Q24.8 ; v2(184.36,10.34) v2(184.36,11.34) ; v2(187.36,12.34) v2(188.36,12.34) v2(188.36,11.34) ; v2(187.36,12.34) v2(186.36,12.34) ; v2(187.36,12.34) v2(187.36,11.34) ; v2(184.36,11.34) v2(185.36,11.34) ; v2(184.36,11.34) v2(184.36,12.34) v2(185.36,12.34) ; v2(185.36,11.34) v2(185.36,12.34) ; v2(185.36,12.34) v2(186.36,12.34) ; v2(188.36,11.34) v2(188.36,10.34) ; v2(188.36,11.34) v2(187.36,11.34) ; v2(188.36,10.34) v2(187.36,10.34) ; v2(188.36,10.34) 188.26,10.24 Q24.5 ; v2(187.36,11.34) v2(187.36,10.34) ; v2(186.36,10.34) v2(187.36,10.34)
5VUSB: length 8.8
  BOTTOM w0.127: R213.1 188.87,109.63 189.46,110.21 189.46,111.18 189.87,111.58 191.11,111.58 v1(194.74,115.21)
12VFMC:
  vias: v2(212.73,45.08) v2(212.73,42.54)
+1.0V_ANALOG_SENSE: length 4.7
  TOP w0.127: v1(112.42,11.58) 109.55,11.58 109.52,11.61
  TOP w0.305: v1(112.42,11.58) 112.61,11.39 U20.2
  vias: v1(108.94,10.52) v1(115.6,17.86) v1(115.57,16.97)
+1.0V_SENSE: length 10.1
  TOP w0.127: FB35.1 138,32.26 138,30.48 139.88,28.6 C408.2
  TOP w0.305: U27.2 143.88,28.41 C408.2
  vias: v1(145.11,34.65) v1(145.08,33.73) v1(146,34.62) v1(145.97,33.71) v1(146.84,34.65) v1(146.81,33.73)
+1.2V_RX_PWR_SENSE: length 10
  TOP w0.127: FB32.1 114.55,30.4 112.98,28.83 112.98,25.04 113.36,24.66 C390.2
  TOP w0.305: U23.2 115,24.42 C390.2
  vias: v1(116.05,30.89) v1(116.05,29.9) v1(117.17,30.89) v1(117.17,29.9) v1(118.19,30.89) v1(118.19,29.9)
+1.5V_SENSE: length 9.8
  TOP w0.127: C419.2 125.12,24.51 124.33,25.3 124.33,30.71 FB36.1
  TOP w0.203: 124.38,31.01 124.59,31.01
  TOP w0.305: C419.2 126.32,24.32 U29.2
  vias: v1(127.51,30.78) v1(127.48,29.79) v1(128.37,30.76) v1(128.35,29.77) v1(129.21,30.78) v1(129.18,29.79)
+1.8V_ANALOG_SENSE: length 4.3
  TOP w0.127: 84.3,28.17 84.23,28.09 C377.2
  TOP w0.305: C377.2 84.04,25.44 U22.2
  vias: v1(89.87,23.37) v1(89.87,22.53) v1(90.93,23.37) v1(90.88,22.56)
+1.8V_RX_PWR_SENSE: length 9.8
  TOP w0.127: v1(123.8,8.48) 122.61,8.48 122.12,8.97 122.12,12.98 123.44,14.3
  TOP w0.203: 123.44,14.3 FB33.1 123.75,14.3
  TOP w0.305: v1(123.8,8.48) 123.96,8.32 U25.2
  vias: v1(125.27,14.71) v1(125.3,13.82) v1(126.14,14.71) v1(126.16,13.82) v1(127,14.71) v1(127.03,13.82)
+2.2V: length 49.1
  TOP w0.254: v1(164.01,12.14) 164.02,12.16 U18.16
  TOP w0.305: v1(121.79,28.45) 121.89,28.35 C385.1 121.89,27.51 v1(121.79,27.41) ; C354.1 119.66,14.38 v1(119.58,14.3) ; v1(120.8,28.42) v1(120.8,27.38)
  L4_SIG w0.203: v1(114.76,21.87) 115.67,22.78 115.67,23.7 117.93,25.96 120.45,25.96 v1(120.83,26.34) ; v1(123.8,5.66) 124.51,6.38 124.51,7.36 arc(124.52,7.41) 124.55,7.45 126.77,9.68 129.54,9.68 130,10.14 v1(130.09,10.14) ; v1(112.42,8.76) 113.11,9.45 113.11,10.34 115.67,12.9 118.49,12.9 v1(118.85,13.26)
  L8_PWR_SIG w0.203: v1(149.94,30.25) 149.83,30.25 149.12,29.54 146.58,29.54 143.69,26.65 v1(143.69,25.81)
  BOTTOM w0.203: v1(85.8,19.43) 83.69,19.43 83.57,19.56 81.92,19.56 81.58,19.89 81.58,20.24 80.31,21.51 80.31,24.56 v1(81.41,25.65)
  vias: v1(85.8,18.54) v1(86.85,19.44) v1(86.85,18.6) v1(87.89,19.44) v1(87.89,18.6) v1(118.75,15.34) v1(118.75,14.3) v1(119.58,15.34) v1(119.68,13.26) v1(121.74,26.34) v1(129.99,12.22) v1(129.99,11.18) v1(130.83,12.22) v1(130.83,11.18) v1(130.93,10.14) v1(132.3,28.15) v1(132.3,27.11) v1(132.4,26.06) v1(133.14,28.15) v1(133.14,27.11) v1(133.24,26.06) v1(149.83,32.33) v1(149.83,31.29) v1(150.67,32.33) v1(150.67,31.29) v1(150.77,30.25) v1(158.98,8.43) v1(159.13,13.03) v1(160.12,8.43) v1(160.27,13.03) v1(161.47,19.38) v1(161.49,18.49) v1(161.8,8.28) v1(161.8,7.42) v1(162.17,12.78) v1(162.61,19.38) v1(162.64,18.49) v1(162.94,8.28) v1(162.92,7.42) v1(164.2,18.87) v1(164.16,17.78) v1(164.39,8.64) v1(164.4,8.03) v1(164.39,7.44)
+2.5VCLK: length 2.3
  TOP w0.381: U32.3 166.42,35.1 166.37,35.15
  vias: v1(95.05,105.46) v1(95.05,103.58) v1(165.91,37.08) v1(165.94,35.99) v1(165.94,35) v1(165.89,34.04) v1(166.83,37.08) v1(166.8,34.04) v1(166.85,35.99) v1(166.85,35) v3(91.41,103.23) v3(91.39,102.64) v3(92.38,103.23) v3(92.38,102.64) v3(92.91,103.23) v3(92.89,102.64) v3(93.45,105.26) v3(93.5,103.78) v3(94.01,105.28) v3(94.03,103.78)
+3.3VCLK: length 8.5
  TOP w0.305: FB3.1 95.89,88.77 v1(95.89,88.14) v1(95.89,87.38) ; v1(95.5,91.59) v1(96.22,91.59) ; 105.6,101.47 v1(105.79,101.47)
  TOP w0.381: 177.32,34.82 178.1,34.04 U11.3
  TOP w0.508: v1(108.46,92.58) 108.46,92.41 v1(108.76,92.1) ; FB11.1 v1(107.31,84.56) v1(107.9,84.56)
  BOTTOM w0.305: v1(96.22,91.59) v1(95.5,91.59) ; v1(95.89,88.14) v1(95.89,87.38)
  vias: v1(95.73,85.32) v1(96.36,84.69) v1(96.52,96.7) v1(96.52,95.81) v1(96.99,85.32) v1(97.41,96.7) v1(97.41,95.81) v1(102.57,100.23) v1(104.44,100.23) v1(105.79,100.58) v1(106.68,101.47) v1(106.68,100.58) v1(107.51,112.08) v1(109.1,110.11) v1(109.76,109.23) v1(177.04,36.63) v1(177.06,35.71) v1(177.09,34.72) v1(177.09,33.76) v1(177.95,36.65) v1(177.98,35.74) v1(178,34.75) v1(178,33.78)
+5VIN: length 108.2
  TOP w0.254: U18.8 167.32,14.16 167.61,14.45
  TOP w0.305: v3(166.23,13.96) 166.24,15.39 167.13,16.26 ; v3(166.23,13.96) 166.43,14.16 U18.8 ; v3(166.23,13.96) v3(166.23,12.36) 166.23,11.49 168.22,9.5 ; 168.61,28.75 168.83,28.98 U32.16 169.09,28.98 169.42,28.65 ; U13.2 89.66,8.94 C317.1
  TOP w0.381: U11.13 178.1,26.04 ; U32.15 167.72,26.67 v1(168.35,26.04)
  L3_PWR w0.508: v1(114.84,106.72) 115.6,105.96 v1(115.6,101.76) 115.6,97.26 v1(115.59,96.91)
  BOTTOM w0.508: v1(190.3,91.68) 189.06,91.68 182.84,85.47 177.29,85.47 170.23,92.53 119.97,92.53 v1(115.59,96.91)
  vias: v1(90.18,18.71) v1(168.38,25.04) v1(169.14,19.35) v1(169.16,25.98) v1(169.19,25.04) v1(170.26,19.35) v1(171.75,19.02) v1(173.25,18.95) v1(174.5,14.73) v1(180.14,25.63) v1(180.16,24.64) v1(180.95,25.58) v1(180.98,24.64) v1(190.32,94.84) v1(190.35,93.88) v1(191.27,93.61) v1(191.29,92.65) v1(191.32,91.71) v1(191.26,38.35) v1(191.26,37.46) v1(192.28,93.64) v1(192.31,92.67) v1(192.33,91.73) v1(192.28,38.35) v1(192.28,37.46) v1(193.32,93.67) v1(193.35,92.7) v1(193.38,91.76) v1(194.29,93.67) v1(194.32,92.7) v1(194.34,91.76) v1(196.09,38.35) v1(196.09,37.46) v1(197.1,38.35) v1(197.1,37.46) v1(201.17,38.35) v1(201.17,37.46) v1(202.18,38.35) v1(202.18,37.46) v3(166.24,14.5) v3(166.24,13.46) v3(166.24,12.88) v3(166.24,11.86) v5(82.65,14.45) v5(83.59,14.45) v5(88.87,8.97) v5(88.87,8.03) v5(88.87,7.04) v5(89.59,8.56) v5(89.81,7.7) v5(89.81,6.76) v5(89.87,20.65) v5(90.81,20.65) v5(117.5,17.86) v5(117.5,16.92) v5(120.07,30.89) v5(120.07,29.95) v5(128.93,14.78) v5(128.93,13.84) v5(131.06,30.89) v5(131.06,29.95) v5(141.2,11.91) v5(142.14,11.91) v5(148.72,34.77) v5(148.72,33.83) v5(167.11,11.13) v5(167.44,5.11) v5(167.44,4.06) v5(167.87,3.07) v5(168.38,4.09) v5(168.58,5.16) v5(169.24,3.05) v5(174.5,15.75) v5(175.51,15.8) v5(175.51,14.73) v5(176.53,14.73) v5(176.58,15.8) v5(179.2,15.88) v5(181.61,13.97) v5(182.88,13.97) v5(184.53,14.61) v5(185.67,14.61)
-1.8V: length 6
  TOP w0.305: v4(92,9.34) 91.9,9.44 U13.1 90.93,9.8 90.93,10.97 ; v4(91.99,8.04) 91.89,7.94 U13.4 91.21,7.85 v4(91.21,6.65)
  BOTTOM w0.305: v4(82.68,12.57) v4(83.46,12.57) 83.82,12.57 C321.1
  vias: v4(84.3,12.57) v4(88.85,10.9) v4(88.85,10.29) v4(89.18,11.84) v4(89.71,10.9) v4(89.71,10.29) v4(90.2,14.68) v4(90.2,13.67) v4(90.6,12.01) v4(90.6,11) v4(91.11,14.66) v4(91.11,13.64) v4(91.52,11.99) v4(91.52,10.97) v4(92,8.91) v4(92,8.47) v4(92.41,9.34) v4(92.41,8.91) v4(92.41,8.47) v4(92.4,8.04)
DVDD: length 200.8
  L3_PWR w0.102: 53.97,71.5 53.97,65.28 54.17,65.08 54.51,65.08 54.73,64.86 54.73,64.85 54.88,64.7 v1(55.15,64.7)
  L3_PWR w0.127: v1(155.3,18.72) 155.3,19.77 154.99,20.07 154.99,33.39 148.36,40.02 147.89,40.02 139.5,48.41 139.2,48.41 135.05,52.56 135.05,53.41 134.77,53.7 134.21,53.7 129.33,58.58 128.75,58.58 128.06,59.26 128.06,60.3 126.95,61.42 126.88,61.42 123.42,64.87 122.66,64.87 120.47,67.06 120.47,67.76 117.6,70.64 116.89,70.64 115.47,72.06 80.72,72.06 79.02,73.76 78.41,73.76 74.8,77.37 62.19,77.37 62.09,77.27 59.47,77.27 58.89,76.69 58.33,76.69 55.46,73.81 55.11,73.81 54.56,73.26 54.56,72.91 53.97,72.33 53.97,71.5
  L3_PWR w0.254: v1(55.15,61.5) 55.3,61.5 55.55,61.75 ; v1(59.95,61.5) v1(60.75,61.5)
  L3_PWR w0.305: v1(55.15,61.5) v1(55.15,62.3) v1(55.15,63.1) v1(55.15,63.9) v1(55.15,64.7) v1(55.15,65.5) v1(55.15,66.3)
  BOTTOM w0.254: C54.1 56.91,64.06 ; 56.91,64.06 56.75,64.06 ; 56.91,64.06 v1(56.75,63.9) ; C53.1 C56.1 C57.1 C58.1 56.88,62.97 v1(56.75,63.1) ; C51.1 C52.1 C55.1 57.71,64.06 v1(57.55,63.9) ; 55.3,65.65 v1(55.15,65.5) v1(55.15,66.3) 55.3,66.15 C60.1 55.3,65.65 ; 55.3,65.65 55.3,65.5
  BOTTOM w0.305: v1(55.15,60.7) 55.25,60.79 C59.1 55.25,61.41 v1(55.15,61.5)
  BOTTOM w0.381: 55.94,63.5 56.34,63.9 ; 56.34,63.9 v1(56.75,63.9) ; 56.34,63.9 v1(55.95,63.9) ; 55.15,65.18 v1(55.15,65.5) 55.3,65.5 55.3,65.35 v1(55.95,64.7) ; 55.15,65.18 v1(55.15,64.7) ; 55.15,65.18 56.77,63.55 ; v1(55.95,62.3) v1(56.75,63.1) ; v1(55.95,62.3) 55.95,62.3 v1(55.15,63.1) ; v1(55.95,62.3) v1(55.15,61.5) 55.15,61.93 ; v1(56.75,63.1) v1(55.95,63.1) 55.95,63.1 ; v1(56.75,63.1) 57.23,63.1 ; v1(56.75,63.9) 56.75,64.06 56.59,64.06 v1(55.95,64.7) ; v1(56.75,63.9) v1(57.55,63.9) v1(58.35,63.9) v1(59.15,63.9) v1(59.95,63.9) v1(60.75,63.9) v1(60.75,63.1) v1(59.95,63.1) v1(59.15,63.1) v1(58.35,63.1) v1(57.55,63.1) 57.23,63.1 ; v1(55.95,64.7) v1(55.15,63.9) ; v1(55.15,64.7) v1(55.95,63.9) ; v1(55.15,64.7) v1(55.15,63.9) ; v1(55.15,63.9) 55.15,63.77 ; v1(55.15,63.9) 55.42,63.9 ; 55.15,63.77 55.42,63.5 ; 55.15,63.77 55.15,63.5 ; 55.15,63.23 55.15,63.5 ; 55.15,63.23 v1(55.15,63.1) ; 55.15,63.23 55.42,63.5 ; 55.15,63.5 55.42,63.5 ; 55.42,63.9 55.42,63.5 ; 55.42,63.9 v1(55.95,63.9) ; v1(55.15,63.1) v1(55.15,62.3) ; v1(55.15,63.1) 55.95,63.1 ; 55.95,63.1 v1(55.15,62.3) ; 56.77,63.55 55.15,61.93 ; 56.77,63.55 57.23,63.1 ; 55.15,61.93 v1(55.15,62.3)
  BOTTOM w0.508: 55.42,63.5 60.75,63.5
  vias: v1(59.95,65.5) v1(60.75,65.5) v1(70.96,72.01) v1(140.72,23.34) v1(140.69,22.25) v1(141.71,23.32) v1(141.68,22.23) v1(142.67,23.32) v1(142.65,22.23) v1(143.64,23.34) v1(143.61,22.25) v1(144.78,23.34) v1(144.75,22.25) v1(145.92,23.34) v1(145.9,22.25)
GND: length 172.6
  TOP w0.102: 59.53,66.87 59.53,67.21 59.82,67.5 60.13,67.5 ; 60.94,68.31 60.63,68.31 60.38,68.06 60.38,67.74 60.43,67.69 60.43,67.56 ; 61.92,67.54 61.92,68.06 61.89,68.09 61.89,68.26 ; 62,69.16 61.94,69.22 61.94,69.86 ; 61.17,69.29 61.17,69.65 61.41,69.89 61.72,69.89 61.86,70.03
  TOP w0.203: C415.2 125.7,28.14 125.5,27.94 v5(125.2,27.94) ; v5(113.74,26.72) 113.79,26.77 v5(113.79,27.71) 114.07,27.71 114.27,27.91 C386.2 114.27,28.24 v5(113.97,28.55)
  TOP w0.254: v5(118.14,35.28) 118.14,35.31 C90.2 ; v3(62.92,71.88) v3(62.92,72.42) 62.92,72.75 C75.2 62.94,73.59 v3(62.92,73.61) ; v5(91.69,104.06) 91.47,103.84 C233.2 ; C237.2 92.84,105.21 v5(92.61,104.98) ; v5(142.65,32.08) 142.95,32.08 143.15,32.28 C406.2 143.15,32.64 142.95,32.84 v5(142.65,32.84) ; C235.2 92.38,103.84 v5(92.61,104.06) 92.84,103.84 C234.2
  TOP w0.305: v5(87.22,26.64) 87.22,26.52 87.53,26.21 C373.2 88.19,26.21 88.16,26.24 v5(88.16,26.62) ; v5(87.22,26.64) 86.09,26.64 C452.2 ; v5(87.22,26.64) 87.12,26.75 v5(86.23,26.75) ; v5(131.75,10.79) 131.42,11.13 C396.2 131.6,12.14 v5(131.75,12.14) ; 99.01,87.07 C261.1 99.01,87.53 v5(99.29,87.81) ; v5(147.72,31.77) 147.73,31.39 147.93,31.18 v5(147.93,31.12) 147.93,31 147.96,30.98 U27.18 ; v2(155.21,9.83) 154.71,10.33 v3(154.71,12.08) v3(154.71,14.12) ; v2(153.21,9.83) 153.71,10.33 U16.5 ; v5(125.3,28.6) 125.5,28.6 C415.2 ; U18.13 v1(163.74,13.66) ; v3(191.72,108.51) 191.71,108.5 U5.10 ; C270.1 105.64,87.55 v5(105.38,87.81) ; C267.2 100.58,87.53 v5(100.3,87.81) ; U29.18 130.4,27.03 v5(130.38,27.05) 130.1,27.33 v5(130.1,27.74) ; U23.18 v5(119.08,27.15) ; U20.18 v5(116.74,14.15) 116.74,14.53 v5(116.54,14.73) ; v5(111.66,15.49) C353.2 111.91,14.99 v5(111.61,14.68) 111.61,14.53 111.38,14.3 v5(111.38,13.82) ; v5(134.06,26.82) 133.71,27.18 C414.2 133.91,28.17 v5(134.06,28.17) ; v5(116.61,35.84) 116.64,35.84 v5(117.2,35.28) 117.45,35.03 C90.2 ; v1(49.55,65.5) v1(49.55,64.7) U1.L20 U1.K20 v1(49.55,62.3) v1(49.55,61.5) ; C260.1 101.6,87.53 v5(101.32,87.81) ; v5(151.59,30.89) 151.26,31.22 C405.2 151.46,32.26 v5(151.59,32.26) ; U20.8 v5(116.74,7.37) ; v5(120.5,15.34) 120.37,15.34 C354.2 120.17,14.33 v5(120.5,14) ; v1(98.88,94.34) 98.73,94.49 C259.1 ; U23.8 119.08,20.45 v5(119.05,20.42) ; U6.11 183.4,115.96 v1(183.59,115.77) ; v5(174.65,30.02) U11.8 176.7,30.02 ; C263.1 v5(99.29,91.87) ; U29.8 v5(130.4,20.32) ; U22.8 v5(79.65,21.34) ; U18.6 v1(167.72,13.16) ; v5(104.37,87.81) 104.09,87.53 R195.1 ; U25.8 v5(128.12,4.29) ; v5(87.91,17.6) 87.91,17.81 C372.2 86.94,17.98 v5(86.56,17.6) ; v2(148.36,26.56) 147.96,26.16 U27.8 ; v5(122.76,28.27) 122.56,28.07 C385.2 ; U25.18 128.12,10.97 v5(128.07,11.02) 128.07,11.71 v5(127.97,11.81) 127.97,11.19 ; v5(174.68,30.68) 174.69,30.67 U11.7 ; v5(99.29,88.82) 99.03,89.08 C262.1 ; v5(119.09,27.74) 119.09,27.18 ; U5.11 190.78,109 v3(190.8,109.02) ; U22.18 v5(86.74,21.34) ; J33.5 v1(190.04,120.73) ; 163.66,13.73 163.3,14.1 163.3,13.81 v1(163.22,13.73) 163.66,13.73
  TOP w0.381: 163.66,13.73 v1(163.74,13.66) ; v5(122.78,10.59) 122.86,10.67 v5(122.86,11.63) 122.99,11.63 123.29,11.94 C397.2 123.29,12.14 122.99,12.45 v5(122.89,12.45) ; v5(99.29,92.89) 99.29,92.89 R153.2 ; C264.1 106.71,97.21 v1(106.5,97.41) ; v5(105.38,92.89) 105.66,92.61 C269.1 ; v5(163.3,14.2) 163.3,14.1 ; U13.6 v1(93.58,8.44) ; v5(100.3,93.9) 100.08,94.13 100.08,94.18
  TOP w0.508: R288.2 v2(205.11,88.27) ; v1(70.07,61.19) 70.07,61.22 v1(67.37,61.22)
  L6_SIG w0.305: 51.48,79.11 51.48,78.97 50.76,78.25 50.76,78.04
  BOTTOM w0.203: v1(55.15,67.1) 54.8,66.75 C459.2
  BOTTOM w0.254: C58.2 C57.2 C56.2 C53.2 ; v1(51.15,70.3) 51.15,70.21 R31.1 ; v1(56.75,64.7) v1(57.55,64.7) v1(58.35,64.7) v1(59.15,64.7) v1(59.95,64.7) v1(60.75,64.7) 60.75,64.66 C51.2 ; v5(117.2,35.28) 117.09,35.28 C88.2 ; 92.4,104.77 v5(92.15,104.52) 91.9,104.77 U2.6 v1(91.9,107.11) ; 92.4,104.77 v5(92.61,104.98) 92.9,105.27 U2.8 92.9,106.41 v1(93.17,106.68) ; 92.4,104.77 U2.7 v1(92.4,106.79) ; v1(63.95,68.7) C115.2 ; v1(55.95,66.3) 55.8,66.15 C60.2 ; v3(67.51,64.29) 67.41,64.19 C84.2 67.41,63.58 ; 67.41,63.37 67.51,63.47 67.41,63.58 ; 67.41,63.37 C85.2 67.41,62.74 v3(67.51,62.64) ; 67.41,63.37 67.41,63.58 ; 55.95,60.32 v1(55.95,59.9) 55.53,59.9 ; 55.95,60.32 v1(55.95,60.7) ; 55.95,60.32 55.53,59.9 ; R20.2 62.18,62.93 v1(62.35,63.1) ; 55.75,61.3 v1(56.75,62.3) v1(57.55,62.3) v1(58.35,62.3) v1(59.15,62.3) v1(59.95,62.3) v1(60.75,62.3) ; v1(61.55,56.7) 61.4,56.85 C69.2 60.9,56.85 v1(60.75,56.7) ; v1(52.75,64.7) 52.6,64.55 C96.2 52.6,64.05 v1(52.75,63.9) ; 55.53,59.9 v1(55.15,59.9) ; 55.8,65.65 v1(55.95,65.5) ; 61.4,70.15 v1(61.55,70.3) v1(60.75,70.3) 60.9,70.15 C68.2 61.4,70.15
  BOTTOM w0.305: C113.2 63.86,67.1 v1(63.95,67.1) ; v1(52.75,62.3) 52.57,62.48 C98.2 52.39,62.4 52.39,61.94 ; v1(52.75,62.3) 52.76,62.31 ; v1(52.75,62.3) 52.39,61.94 ; v1(52.75,62.3) 53.16,61.89 C465.2 ; 111.58,92.33 111.48,92.23 v1(110.03,92.23) v1(109.42,92.23) ; v1(51.95,67.1) v1(52.75,67.1) ; v1(51.95,67.1) v1(51.15,67.1) ; v1(51.95,67.1) 51.68,67.37 C62.2 ; v1(52.75,67.1) 52.92,66.93 C106.2 ; v1(52.75,67.1) C77.2 ; 52.39,61.94 52.39,61.86 ; C272.2 190.83,109.04 v3(190.8,109.02) ; v3(191.26,105.99) 191.39,106.12 C283.2 191.69,106.25 v1(191.95,105.99) ; C55.2 59.02,64.57 v1(59.15,64.7) ; 52.92,64.87 52.95,64.87 52.99,64.91 53.07,65.04 ; 52.92,64.87 53.12,65.07 C464.2 ; 52.92,64.87 v1(52.75,64.7) 52.34,65.11 C108.2 ; R272.1 128.42,6.38 v2(128.52,6.47) ; C92.2 50.36,62.3 v1(50.35,62.3) ; 111.58,93.73 111.2,94.11 v1(110.03,94.11) v1(109.42,94.11) ; C118.2 63.87,65.5 v1(63.95,65.5) ; v1(50.35,67.1) v1(51.15,67.1) ; v1(51.15,67.1) 51.15,67.01 ; R244.2 154.2,8.84 v2(154.21,8.83) ; 155.58,8.84 v2(155.21,8.83) ; J32.B7 v2(214,81.91) ; C430.2 50.46,58.3 v1(50.35,58.3) ; v1(39.4,71.4) 39.7,71.7 T1.1 40.06,71.7 v1(40.34,71.42) ; C102.2 51.32,64.87 v1(51.15,64.7) ; 52.39,61.86 v1(51.95,62.3) 51.87,62.38 C431.2 ; 52.39,61.86 C109.2 ; v1(50.35,64.7) 50.53,64.52 C94.2 ; v1(55.95,61.5) 55.75,61.3 C59.2 55.75,60.1 v1(55.95,59.9) ; v1(55.95,61.5) 55.95,61.51 C121.2 56.9,62.46 C58.2 ; v1(55.95,61.5) v1(55.95,60.7) v1(55.15,59.9) 54.75,60.3 C460.2 ; R300.1 163.8,30.92 v5(163.81,30.93) ; J32.C8 v2(212.73,78.11) ; R259.1 82.19,21.8 v2(82.19,21.74) ; v1(50.35,69.5) v1(50.35,70.3) ; 52.76,62.31 52.76,62.41 ; 52.76,62.31 53.01,62.56 C100.2 ; C52.2 59.82,64.57 v1(59.95,64.7) 60.08,64.57 C51.2 ; v1(63.95,58.3) 63.86,58.3 C116.2 ; v1(58.35,64.7) 58.22,64.57 57.42,64.57 ; v2(176.9,29.62) 176.68,29.85 176.53,29.85 ; v1(63.95,59.9) 63.86,59.9 C112.2 ; C119.2 v1(63.95,61.5) ; C65.2 50.45,59.1 v1(50.35,59.1) ; C64.2 50.46,67.9 v1(50.35,67.9) ; 57.42,64.57 v1(57.55,64.7) ; 57.42,64.57 C54.2 56.88,64.57 ; v1(50.35,59.9) v1(51.15,59.9) v1(51.95,59.9) v1(52.75,59.9) ; v3(190.53,105.99) 190.47,106.05 C282.2 ; 51.3,62.09 51.3,62.15 v1(51.15,62.3) ; v3(184.81,114.2) 184.81,114.19 v3(184.81,113.37) 184.81,112.53 v3(184.81,112.52) ; 56.34,65.1 56.34,65.11 v1(55.95,65.5) ; 56.34,65.1 56.87,64.57 56.88,64.57 ; 56.34,65.1 56.35,65.1 v1(56.75,64.7) 56.88,64.57 ; 56.34,65.1 55.8,65.64 C60.2 ; v1(103.56,84.12) 103.56,82.02 103.53,81.99 ; C123.2 55.04,67.21 v1(55.15,67.1) 55.05,67.1 55.04,67.11 ; 165.02,28.88 164.97,28.93 R299.1 ; v3(189.99,109.98) 190.04,110.03 C273.1 ; v1(52.75,59.9) 53.15,59.5 C429.2 ; v1(52.75,59.9) 53.07,60.22 C105.2 ; C79.2 50.44,66.3 v1(50.35,66.3) ; 50.44,68.71 v1(50.35,68.7) ; J32.B3 v2(214,86.99) ; v2(82.19,22.54) 81.99,22.73 R258.1 ; J32.C4 v2(212.73,83.19) ; J32.D7 v1(211.46,81.91)
  BOTTOM w0.381: v1(32.26,79.94) 32.29,79.95 C205.1 ; C217.1 v1(29.33,71.93) ; v1(33.15,79.46) C210.2 ; v1(31.32,71.94) C212.2 ; C209.2 v1(36.12,82.47) ; C190.2 v1(33.93,48.36) ; C208.1 v1(34.37,83.47) ; C111.2 v1(71.53,56.64) ; C207.1 v1(35.17,83.01) ; C213.2 v1(30.35,71.88)
  BOTTOM w0.508: U19.2 v5(116.54,14.73) 116.54,14.35 v5(116.74,14.15) ; C285.2 183.31,119.78 v1(183.51,119.58) ; C189.1 v1(34.42,43.47) ; C293.1 v1(175.56,107.34) ; v1(49.55,55.9) 49.56,55.91 C110.2 50.34,55.91 v1(50.35,55.9) ; v2(117.88,22.57) 117.7,22.4 R263.1 ; C201.1 v1(29.28,54.69) ; v1(183.59,115.77) 183.26,116.1 v3(183.18,116.1) ; R298.1 v2(166.02,29.08) ; C219.1 v1(30.28,67.73) ; v5(162.69,14.73) 162.51,14.55 162.05,14.55 v5(161.87,14.73) ; R214.2 187.71,105.56 Y2.4 187.64,105.55 v1(188.04,105.16) ; C220.1 v1(29.35,67.72) ; v1(175.53,100.36) 175.52,100.36 C295.1 ; v1(175.64,103.78) 175.51,103.91 C294.2 ; R299.1 v2(165.22,29.08) ; R224.1 176.53,29.85 176.7,30.02 ; C292.2 175.56,110.97 v1(175.77,110.77) ; v1(30.3,54.69) 30.23,54.76 C193.2 ; C188.1 v1(35.3,43.98)
  vias: v1(1.22,79.53) v1(1.17,77.8) v1(1.17,75.97) v1(1.22,64.36) v1(1.19,62.08) v1(1.32,71.15) v1(1.32,56.85) v1(1.27,54.97) v1(1.27,50.57) v1(1.27,48.84) v1(1.32,47.24) v1(1.37,69.32) v1(1.5,81.03) v1(1.47,45.87) v1(2.54,78.74) v1(2.54,76.2) v1(2.54,63.5) v1(2.54,48.26) v1(2.79,56.82) v1(2.9,71.15) v1(2.87,54.94) v1(2.95,69.32) v1(3.51,42.21) v1(4.04,84.89) v1(4.19,41.88) v1(4.42,56.85) v1(4.45,54.97) v1(4.7,71.15) v1(4.75,69.32) v1(5,39.6) v1(5.13,86.54) v1(5.08,78.74) v1(5.08,76.2) v1(5.08,73.66) v1(5.08,66.04) v1(5.08,63.5) v1(5.08,58.42) v1(5.08,53.34) v1(5.08,50.8) v1(5.08,48.26) v1(5.16,40.21) v1(5.44,84.07) v1(5.46,42.67) v1(6.12,71.45) v1(6.38,56.85) v1(6.38,55.02) v1(6.5,85.75) v1(6.6,83.44) v1(6.73,41.07) v1(6.81,43.43) v1(6.86,69.75) v1(7.12,72.25) v1(7.11,36.37) v1(7.62,91.44) v1(7.57,82.78) v1(7.62,78.74) v1(7.62,76.2) v1(7.62,73.66) v1(7.62,68.58) v1(7.62,66.04) v1(7.62,53.34) v1(7.62,50.8) v1(7.62,48.26) v1(7.62,45.72) v1(7.67,85.09) v1(7.72,35.2) v1(7.77,44.2) v1(7.9,57.12) v1(7.95,41.88) v1(8.33,92.89) v1(8.41,73.41) v1(8.45,70.99) v1(8.59,81.94) v1(8.64,45.19) v1(8.56,33.81) v1(8.79,55.47) v1(8.89,84.12) v1(9.17,42.95) v1(9.25,94.28) v1(9.25,71.73) v1(9.37,57.91) v1(9.42,32.23) v1(9.6,80.77) v1(9.63,46.53) v1(10.03,95.73) v1(10.08,83.06) v1(10.13,73.96) v1(10.16,93.98) v1(10.16,91.44) v1(10.16,88.9) v1(10.16,86.36) v1(10.16,78.74) v1(10.16,76.2) v1(10.19,72.14) v1(10.16,68.58) v1(10.16,66.04) v1(10.16,53.34) v1(10.16,50.8) v1(10.19,44.17) v1(10.16,40.64) v1(10.16,38.1) v1(10.16,35.56) v1(10.16,33.02) v1(10.24,30.73) v1(10.54,58.83) v1(10.54,56.34) v1(10.52,47.62) v1(10.72,79.55) v1(10.82,96.88) v1(11.1,81.89) v1(11.13,29.26) v1(11.18,45.52) v1(11.33,97.97) v1(11.51,59.84) v1(11.63,49.1) v1(11.71,78.49) v1(11.76,57.43) v1(11.89,73.99) v1(11.94,72.16) v1(12.07,46.61) v1(12.22,80.67) v1(12.7,96.52) v1(12.7,93.98) v1(12.7,91.44) v1(12.7,88.9) v1(12.7,86.36) v1(12.7,83.82) v1(12.7,77.37) v1(12.7,68.58) v1(12.7,63.5) v1(12.7,55.88) v1(12.7,53.34) v1(12.65,50.42) v1(12.7,45.72) v1(12.7,43.18) v1(12.7,40.64) v1(12.7,38.1) v1(12.7,35.56) v1(12.7,33.02) v1(12.7,30.48) v1(13.21,79.6) v1(13.18,48.08) v1(13.39,102.03) v1(13.61,76.38) v1(13.74,51.82) v1(13.84,74.04) v1(13.84,59.56) v1(13.89,72.21) v1(14.07,25.6) v1(14.2,101.9) v1(14.2,78.49) v1(14.2,49.4) v1(14.63,53.01) v1(14.66,75.23) v1(14.81,104.24) v1(14.81,63.09) v1(14.91,60.58) v1(14.91,23.8) v1(15.11,77.5) v1(15.24,103.58) v1(15.24,96.52) v1(15.24,93.98) v1(15.24,91.44) v1(15.24,88.9) v1(15.24,86.36) v1(15.24,83.82) v1(15.24,81.28) v1(15.24,78.74) v1(15.24,68.58) v1(15.24,66.04) v1(15.24,55.88) v1(15.24,48.26) v1(15.24,43.18) v1(15.24,40.64) v1(15.24,38.1) v1(15.24,35.56) v1(15.24,33.02) v1(15.24,30.48) v1(15.29,50.8) v1(15.44,54.18) v1(15.65,101.07) v1(15.72,26.57) v1(15.75,74.02) v1(15.8,72.19) v1(16.15,76.35) v1(16.18,51.99) v1(16.38,55.4) v1(16.56,63.78) v1(16.64,24.79) v1(16.69,102.74) v1(16.94,19.58) v1(16.97,100.36) v1(16.99,53.16) v1(17.04,27.58) v1(17.07,108.05) v1(17.25,75.13) v1(17.32,56.62) v1(17.4,72.16) v1(17.58,28.78) v1(17.7,60.17) v1(17.78,109.22) v1(17.78,96.52) v1(17.78,93.98) v1(17.78,91.44) v1(17.78,88.9) v1(17.78,86.36) v1(17.78,83.82) v1(17.78,81.28) v1(17.78,78.74) v1(17.78,76.2) v1(17.78,53.34) v1(17.78,50.8) v1(17.78,43.18) v1(17.78,40.64) v1(17.78,38.1) v1(17.78,35.56) v1(17.78,33.02) v1(17.91,101.93) v1(17.93,58.9) v1(17.93,54.38) v1(17.96,99.47) v1(17.98,25.81) v1(17.98,17.88) v1(18.08,63.96) v1(18.14,62.05) v1(18.24,74.04) v1(18.19,71.37) v1(18.16,57.66) v1(18.21,30.2) v1(18.36,66.52) v1(18.54,61.19) v1(18.64,98.17) v1(18.59,67.82) v1(18.77,58.5) v1(18.8,31.52) v1(18.82,26.95) v1(18.87,55.6) v1(19.09,17.02) v1(19.15,70.46) v1(19.3,59.49) v1(19.38,96.82) v1(19.43,74.07) v1(19.35,32.74) v1(19.35,28.14) v1(19.51,100.46) v1(19.58,110.19) v1(19.71,56.64) v1(19.76,63.96) v1(19.76,62.05) v1(19.89,72.19) v1(19.96,34.11) v1(19.99,29.57) v1(20.1,65.61) v1(20.19,99.16) v1(20.32,109.22) v1(20.32,106.68) v1(20.32,104.14) v1(20.32,101.6) v1(20.27,95.4) v1(20.32,91.44) v1(20.32,88.9) v1(20.32,86.36) v1(20.32,83.82) v1(20.32,81.28) v1(20.32,78.74) v1(20.32,76.2) v1(20.27,61.86) v1(20.32,55.88) v1(20.32,53.34) v1(20.32,50.8) v1(20.32,40.64) v1(20.32,38.1) v1(20.32,27.94) v1(20.32,25.4) v1(20.32,22.86) v1(20.32,20.32) v1(20.32,17.78) v1(20.41,67.44) v1(20.52,16.33) v1(20.6,35.53) v1(20.57,30.89) v1(20.7,74.04) v1(20.68,70.08) v1(20.65,61.44) v1(20.67,59.54) v1(20.7,57.4) v1(20.74,48.8) v1(20.78,72.02) v1(20.93,97.82) v1(20.98,94.13) v1(21.13,42.09) v1(21.13,32.11) v1(21.18,111.02) v1(21.18,36.88) v1(21.34,68.71) v1(21.39,63.91) v1(21.44,62.05) v1(21.53,67.47) v1(21.58,47.18) v1(21.67,92.89) v1(21.69,65.61) v1(21.74,33.48) v1(21.82,96.39) v1(21.77,38.15) v1(22.12,57.33) v1(22.15,73.96) v1(22.15,72.06) v1(22.23,70.05) v1(22.3,61.49) v1(22.28,59.51) v1(22.33,39.45) v1(22.34,15.48) v1(22.43,91.49) v1(22.38,34.9) v1(22.53,95.12) v1(22.86,109.22) v1(22.86,106.68) v1(22.86,104.14) v1(22.86,101.6) v1(22.86,88.9) v1(22.86,86.36) v1(22.86,83.82) v1(22.86,81.28) v1(22.86,78.74) v1(22.86,76.2) v1(22.86,55.88) v1(22.86,53.34) v1(22.86,45.72) v1(22.86,43.18) v1(22.89,40.69) v1(22.86,33.02) v1(22.86,30.48) v1(22.86,27.94) v1(22.86,25.4) v1(22.86,22.86) v1(22.86,20.32) v1(22.86,17.78) v1(22.98,111.98) v1(22.95,67.47) v1(23.02,49.7) v1(22.96,36.25) v1(23.22,93.88) v1(23.16,90.25) v1(23.17,65.59) v1(23.44,63.97) v1(23.5,73.99) v1(23.52,57.38) v1(23.57,72.02) v1(23.55,70.03) v1(23.55,59.52) v1(23.55,37.52) v1(23.66,47.9) v1(23.65,42.27) v1(23.93,88.9) v1(23.98,92.48) v1(24.1,38.81) v1(24.28,63.91) v1(24.26,62.59) v1(24.31,31.9) v1(24.71,91.24) v1(24.69,87.55) v1(24.69,67.52) v1(24.71,40.21) v1(24.84,43.23) v1(24.89,59.64) v1(25.02,72.14) v1(25.02,57.33) v1(25.11,50.52) v1(25.3,20.35) v1(25.38,109.27) v1(25.4,106.68) v1(25.4,104.14) v1(25.4,101.6) v1(25.4,99.06) v1(25.4,96.52) v1(25.4,93.98) v1(25.4,91.44) v1(25.4,83.82) v1(25.4,81.28) v1(25.4,78.74) v1(25.4,76.2) v1(25.4,45.72) v1(25.4,38.1) v1(25.4,35.56) v1(25.4,30.48) v1(25.4,27.94) v1(25.4,25.4) v1(25.4,22.86) v1(25.37,17.92) v1(25.48,89.89) v1(25.55,41.4) v1(25.78,48.75) v1(25.91,43.99) v1(26.04,86.23) v1(25.96,61.59) v1(26.24,88.54) v1(26.24,70.08) v1(26.31,67.5) v1(26.29,57.4) v1(26.36,72.1) v1(26.4,59.52) v1(26.38,55.24) v1(26.38,12.83) v1(26.75,39.75) v1(26.85,42.06) v1(27.02,87.82) v1(27.13,114.84) v1(27.13,85.52) v1(27.14,51.51) v1(27.26,44.63) v1(27.36,14.56) v1(27.82,54.68) v1(27.84,49.76) v1(27.84,20.35) v1(27.81,17.95) v1(27.87,113.59) v1(27.94,104.14) v1(27.94,101.6) v1(27.94,99.06) v1(27.94,96.52) v1(27.94,93.98) v1(27.94,91.44) v1(27.94,83.82) v1(27.94,76.2) v1(27.94,61.49) v1(27.94,40.64) v1(27.94,38.1) v1(27.94,33.02) v1(27.94,30.48) v1(27.94,27.94) v1(27.94,25.4) v1(27.94,22.86) v1(27.97,109.5) v1(27.99,77.65) v1(28.09,106.79) v1(28.11,65.62) v1(28.09,59.64) v1(28.14,42.85) v1(28.11,15.81) v1(28.06,11.75) v1(28.19,47.85) v1(28.3,72.14) v1(28.3,45.31) v1(28.35,87.27) v1(28.42,84.86) v1(28.69,112.17) v1(28.67,67.47) v1(28.83,115.87) v1(28.84,16.99) v1(28.85,89.71) v1(29.04,13.48) v1(29.36,110.96) v1(29.4,86.46) v1(29.36,59.16) v1(29.36,52.73) v1(29.41,43.48) v1(29.46,84.2) v1(29.56,114.58) v1(29.68,50.76) v1(29.68,46.02) v1(29.8,14.73) v1(30.03,39.8) v1(29.98,18.15) v1(30.13,37.12) v1(30.3,59.13) v1(30.39,113.2) v1(30.38,20.35) v1(30.35,15.81) v1(30.48,101.6) v1(30.48,99.06) v1(30.48,96.52) v1(30.48,93.98) v1(30.48,91.44) v1(30.48,76.2) v1(30.46,65.61) v1(30.48,53.48) v1(30.48,30.48) v1(30.48,27.94) v1(30.48,25.4) v1(30.49,22.98) v1(30.58,109.42) v1(30.58,106.88) v1(30.58,104.34) v1(30.56,89.08) v1(30.57,67.47) v1(30.63,44.3) v1(30.77,110.02) v1(30.78,85.88) v1(30.89,112.12) v1(31.04,83.39) v1(31.12,16.64) v1(31.24,19.01) v1(31.29,59.21) v1(31.42,51.87) v1(31.36,35.8) v1(31.37,31.85) v1(31.45,111.74) v1(31.53,65.18) v1(31.6,61.73) v1(31.92,85.16) v1(31.88,17.28) v1(31.95,76.17) v1(32.09,109.34) v1(32.33,47.24) v1(32.29,14.31) v1(32.36,38.71) v1(32.46,61.57) v1(32.5,19.57) v1(32.52,9.28) v1(32.56,59.64) v1(32.77,111.06) v1(32.88,114.06) v1(32.94,20.5) v1(33.02,96.52) v1(33.02,93.98) v1(33.02,91.44) v1(33.02,88.9) v1(33.02,78.74) v1(33.03,35.52) v1(33.02,33.02) v1(33.02,30.48) v1(32.96,27.9) v1(32.96,25.36) v1(33.03,22.98) v1(33.14,104.27) v1(33.14,101.73) v1(33.14,99.19) v1(33.06,58.01) v1(33.1,56.25) v1(33.12,47.71) v1(33.14,17.84) v1(33.2,106.91) v1(33.19,55.29) v1(33.28,118.29) v1(33.39,70.59) v1(33.38,61.59) v1(33.56,108.67) v1(33.62,37.26) v1(33.67,67.43) v1(33.81,20.11) v1(34.09,64.14) v1(34.24,110.38) v1(34.24,65.05) v1(34.29,77.7) v1(34.51,56.21) v1(34.46,18.38) v1(34.57,71.93) v1(34.59,68.86) v1(34.61,58.02) v1(34.57,53.47) v1(34.59,41.3) v1(34.64,8.12) v1(34.72,67.64) v1(34.85,38.62) v1(34.89,16.84) v1(34.89,14.3) v1(34.89,11.76) v1(34.96,119.25) v1(35.02,107.89) v1(35.04,59.18) v1(35.09,42.24) v1(35.15,20.67) v1(35.26,116.61) v1(35.26,114.07) v1(35.26,111.53) v1(35.34,54.49) v1(35.38,49.99) v1(35.5,27.9) v1(35.5,25.36) v1(35.61,96.58) v1(35.61,94.04) v1(35.61,91.5) v1(35.61,88.96) v1(35.56,83.82) v1(35.56,73.66) v1(35.56,35.56) v1(35.56,33.02) v1(35.56,30.48) v1(35.57,22.98) v1(35.7,109.6) v1(35.73,104.33) v1(35.73,101.79) v1(35.73,99.25) v1(35.69,63.73) v1(35.66,63.02) v1(35.66,61.7) v1(35.8,18.94) v1(35.86,40.09) v1(36.04,43.54) v1(36.12,79.1) v1(36.07,70.71) v1(36.08,48.25) v1(36.16,65.96) v1(36.37,68.61) v1(36.43,52.47) v1(36.49,107.16) v1(36.6,59.16) v1(36.55,21.22) v1(36.74,74.7) v1(36.7,65.33) v1(36.73,58) v1(36.7,41.28) v1(36.75,55.47) v1(37.01,80.49) v1(37.03,46.74) v1(37.03,32.99) v1(37.17,108.87) v1(37.2,19.5) v1(37.31,78.38) v1(37.43,16.84) v1(37.43,14.3) v1(37.43,11.88) v1(37.54,60.86) v1(37.47,42.88) v1(37.8,116.61) v1(37.8,114.07) v1(37.8,111.53) v1(37.85,106.46) v1(37.87,21.76) v1(38.04,27.9) v1(38.04,25.36) v1(38.13,91.29) v1(38.13,88.75) v1(38.13,86.21) v1(38.1,38.1) v1(38.17,104.43) v1(38.17,101.89) v1(38.17,99.35) v1(38.19,96.73) v1(38.21,22.88) v1(38.37,40.76) v1(38.52,108.18) v1(38.53,79.73) v1(38.51,77.67) v1(38.47,49.68) v1(38.48,35.51) v1(38.5,24.01) v1(38.51,20.04) v1(38.82,25.06) v1(38.85,5.39) v1(39.01,56.16) v1(39.01,45.03) v1(39.09,59.22) v1(39.1,26.32) v1(39.32,105.74) v1(39.32,70.69) v1(39.32,68.28) v1(39.27,64.47) v1(39.31,48.08) v1(39.37,79.22) v1(39.43,27.63) v1(39.64,122.2) v1(39.58,104.69) v1(39.55,80.7) v1(39.62,77.04) v1(39.65,6.78) v1(39.81,20.9) v1(39.85,84.61) v1(39.85,28.84) v1(39.91,16.8) v1(39.91,14.26) v1(40,107.45) v1(39.98,103.46) v1(39.98,62.99) v1(39.98,61.59) v1(39.98,60.91) v1(39.98,45.41) v1(39.97,11.88) v1(40.1,97.07) v1(40.24,102.41) v1(40.23,70.69) v1(40.21,22.22) v1(40.34,116.61) v1(40.34,114.07) v1(40.34,111.53) v1(40.27,73.38) v1(40.27,53.59) v1(40.39,108.99) v1(40.37,95.93) v1(40.41,38.23) v1(40.49,120.76) v1(40.54,101.09) v1(40.51,81.69) v1(40.51,78.56) v1(40.53,23.58) v1(40.48,8.27) v1(40.59,68.3) v1(40.61,4.43) v1(40.74,86.28) v1(40.68,56.28) v1(40.78,24.49) v1(40.95,99.78) v1(40.95,47.19) v1(41.23,106.58) v1(41.2,25.79) v1(41.15,18.86) v1(41.21,9.49) v1(41.32,119.15) v1(41.33,97.37) v1(41.33,75.74) v1(41.35,123.19) v1(41.39,98.55) v1(41.42,5.82) v1(41.46,59.51) v1(41.49,27.12) v1(41.6,96.26) v1(41.58,67.54) v1(41.55,65.13) v1(41.65,105.27) v1(41.79,28.34) v1(41.76,10.92) v1(41.94,103.93) v1(41.91,21.46) v1(41.99,52.38) v1(42.13,121.78) v1(42.06,118) v1(42.11,12.25) v1(42.18,103.02) v1(42.2,61.18) v1(42.21,7.2) v1(42.33,13.85) v1(42.41,54.73) v1(42.37,29.44) v1(42.49,114.11) v1(42.49,111.57) v1(42.52,47.52) v1(42.49,45.03) v1(42.57,116.82) v1(42.59,101.74) v1(42.55,77.01) v1(42.61,41.16) v1(42.7,86.09) v1(42.65,30.57) v1(42.67,15.38) v1(42.79,107.71) v1(42.8,56.42) v1(42.75,24.25) v1(42.83,16.88) v1(42.89,100.37) v1(42.85,8.58) v1(42.97,115.19) v1(43.11,120.15) v1(43.09,99.07) v1(43.23,65.86) v1(43.15,18.46) v1(43.33,68.25) v1(43.26,50.95) v1(43.38,113.52) v1(43.43,80.35) v1(43.36,19.97) v1(43.53,10.27) v1(43.63,29.13) v1(43.7,112.07) v1(43.71,104.71) v1(43.71,65.05) v1(43.68,21.3) v1(43.76,118.88) v1(43.78,37.15) v1(43.92,76.68) v1(43.89,58.72) v1(43.93,42.55) v1(43.88,30.24) v1(43.96,90.01) v1(43.96,84.63) v1(43.99,74.93) v1(43.98,11.87) v1(44.06,110.61) v1(44.07,43.64) v1(44.21,22.65) v1(44.2,13.47) v1(44.31,101.68) v1(44.25,27.41) v1(44.44,109.07) v1(44.51,117.23) v1(44.48,65.81) v1(44.48,23.63) v1(44.54,15.01) v1(44.61,45.67) v1(44.71,81.94) v1(44.7,16.5) v1(44.66,8.68) v1(44.81,107.64) v1(44.83,63.04) v1(44.76,24.83) v1(44.76,6.22) v1(44.82,2.09) v1(44.91,115.6) v1(44.88,61.7) v1(45.01,18.08) v1(45.1,106.32) v1(45.19,29.43) v1(45.17,26.2) v1(45.33,113.94) v1(45.26,76.1) v1(45.34,73.63) v1(45.26,68.1) v1(45.34,47.41) v1(45.33,19.42) v1(45.41,80.06) v1(45.52,125.64) v1(45.5,121.15) v1(45.46,61.14) v1(45.5,59.4) v1(45.53,27.44) v1(45.64,112.48) v1(45.59,98.53) v1(45.66,104.99) v1(45.75,20.73) v1(45.92,103.95) v1(45.9,97.41) v1(45.85,67.54) v1(45.85,65.79) v1(46,111.02) v1(46.01,69.26) v1(45.99,31.82) v1(46.11,102.47) v1(46.12,48.86) v1(46.07,34.62) v1(46.05,22.1) v1(46.1,1.29) v1(46.25,70.99) v1(46.31,58) v1(46.34,41.89) v1(46.3,23.01) v1(46.39,109.48) v1(46.38,78.13) v1(46.41,56.19) v1(46.45,101.3) v1(46.64,85.24) v1(46.58,74.8) v1(46.65,53) v1(46.72,42.97) v1(46.74,40) v1(46.65,24.35) v1(46.65,18.46) v1(46.65,15.92) v1(46.65,13.38) v1(46.65,10.84) v1(46.71,8.78) v1(46.71,6.24) v1(46.75,108.06) v1(46.84,98.88) v1(46.81,61.14) v1(46.81,59.36) v1(46.78,37.09) v1(46.9,126.06) v1(46.89,100.06) v1(46.95,87.22) v1(47.01,25.64) v1(47.11,106.86) v1(47.17,97.74) v1(47.23,82.9) v1(47.17,77.14) v1(47.24,49.99) v1(47.24,44.89) v1(47.21,26.94) v1(47.52,119.65) v1(47.52,117.11) v1(47.46,105.41) v1(47.47,46.7) v1(47.56,80.68) v1(47.74,114.61) v1(47.74,112.07) v1(47.74,109.53) v1(47.7,104.5) v1(47.65,72.03) v1(47.88,67.54) v1(47.87,48.15) v1(47.89,27.96) v1(47.97,79) v1(47.96,65.79) v1(47.98,57.98) v1(48.14,103.06) v1(48.08,75.96) v1(48.1,56.21) v1(48.21,61.14) v1(48.16,59.39) v1(48.22,39.45) v1(48.17,29.09) v1(48.34,87.7) v1(48.41,101.85) v1(48.46,43.14) v1(48.64,78.1) v1(48.63,75.2) v1(48.66,100.53) v1(48.69,73.53) v1(48.94,82.71) v1(49.06,46.17) v1(49.15,27.65) v1(49.2,23.47) v1(49.2,20.93) v1(49.2,18.39) v1(49.2,15.85) v1(49.2,13.31) v1(49.27,49.48) v1(49.3,35.68) v1(49.26,11.25) v1(49.26,8.71) v1(49.32,6.4) v1(49.4,28.76) v1(49.48,91.48) v1(49.47,77.02) v1(49.52,40.92) v1(49.55,71.1) v1(49.55,68.7) v1(49.55,67.9) v1(49.55,59.1) v1(49.55,58.3) v1(49.71,86.16) v1(49.69,42.53) v1(49.81,73.57) v1(49.9,79.91) v1(50.14,44.29) v1(50.23,106.91) v1(50.23,104.37) v1(50.23,101.83) v1(50.15,76.05) v1(50.19,53.49) v1(50.31,119.65) v1(50.31,117.11) v1(50.31,114.57) v1(50.31,112.03) v1(50.31,109.49) v1(50.28,83.28) v1(50.35,71.1) v1(50.35,65.5) v1(50.35,61.5) v1(50.35,60.7) v1(50.35,57.5) v1(50.35,56.7) v1(50.37,48.77) v1(50.52,50.89) v1(50.73,75.24) v1(50.9,72.1) v1(50.87,45.88) v1(50.97,81.57) v1(51.01,54.95) v1(51.15,71.1) v1(51.15,56.7) v1(51.15,55.9) v1(51.23,26.77) v1(51.58,52.42) v1(51.72,79.66) v1(51.69,47.38) v1(51.69,40.35) v1(51.74,23.47) v1(51.74,20.93) v1(51.74,18.39) v1(51.74,15.85) v1(51.74,13.31) v1(51.8,11.25) v1(51.8,8.71) v1(51.81,6.29) v1(51.95,86.76) v1(51.95,70.3) v1(51.95,56.7) v1(52.09,1.17) v1(52.17,38.49) v1(52.28,77.49) v1(52.34,41.74) v1(52.36,88.76) v1(52.38,73.14) v1(52.43,3.56) v1(52.51,126.05) v1(52.55,54.2) v1(52.62,49.9) v1(52.74,75.93) v1(52.77,106.91) v1(52.77,104.37) v1(52.77,101.83) v1(52.81,84.18) v1(52.75,70.3) v1(52.75,56.7) v1(52.83,43.58) v1(52.93,122.44) v1(52.85,119.65) v1(52.85,117.11) v1(52.85,114.57) v1(52.85,112.03) v1(52.85,109.49) v1(53,45.19) v1(53.11,74.28) v1(53.18,51.72) v1(53.25,98.44) v1(53.25,95.9) v1(53.4,80.11) v1(53.4,46.9) v1(53.47,53.47) v1(53.58,72.72) v1(53.55,71.1) v1(53.55,70.3) v1(53.55,56.7) v1(53.55,55.9) v1(53.89,78.22) v1(53.85,39.9) v1(53.9,31.78) v1(54,42.41) v1(54.09,1.23) v1(54.2,29.19) v1(54.32,76.61) v1(54.29,49.26) v1(54.28,26.39) v1(54.28,23.47) v1(54.28,20.93) v1(54.28,18.39) v1(54.28,15.85) v1(54.28,13.31) v1(54.28,11.21) v1(54.28,8.67) v1(54.35,70.3) v1(54.35,56.7) v1(54.35,6.29) v1(54.43,3.62) v1(54.72,99.67) v1(54.84,74.72) v1(54.93,51.27) v1(55.05,126.05) v1(55.24,73.15) v1(55.15,70.3) v1(55.15,56.7) v1(55.22,53.11) v1(55.31,106.91) v1(55.31,104.37) v1(55.31,101.83) v1(55.39,119.65) v1(55.39,117.11) v1(55.39,114.57) v1(55.39,112.03) v1(55.39,109.49) v1(55.44,34.82) v1(55.47,122.44) v1(55.67,49.9) v1(55.84,84.15) v1(55.8,82.03) v1(55.84,79.12) v1(55.95,71.1) v1(55.95,70.3) v1(55.95,67.1) v1(55.95,56.7) v1(55.95,55.9) v1(56.25,72.93) v1(56.38,95.93) v1(56.44,31.78) v1(56.53,53.02) v1(56.54,42.41) v1(56.61,75.91) v1(56.68,51.5) v1(56.72,48.79) v1(56.74,29.19) v1(56.75,70.3) v1(56.75,56.7) v1(56.79,50.02) v1(56.93,77.86) v1(56.85,26.42) v1(56.85,23.51) v1(56.85,20.97) v1(56.85,18.43) v1(57.01,47.43) v1(56.96,15.82) v1(56.96,13.28) v1(56.96,11.17) v1(56.96,8.63) v1(57.03,6.25) v1(57.2,45.31) v1(57.44,80.06) v1(57.5,43.35) v1(57.55,70.3) v1(57.55,56.7) v1(57.7,109.46) v1(57.7,106.92) v1(57.7,104.38) v1(57.66,81.71) v1(57.83,119.69) v1(57.83,117.15) v1(57.83,114.61) v1(57.83,112.07) v1(57.79,34.42) v1(57.91,122.48) v1(57.99,83.86) v1(57.95,72.6) v1(57.98,41.62) v1(58,38.51) v1(58.28,53) v1(58.41,88.58) v1(58.38,75.64) v1(58.35,71.1) v1(58.35,70.3) v1(58.35,56.7) v1(58.35,55.9) v1(58.45,51.58) v1(58.45,40.3) v1(58.61,77.4) v1(58.57,50.21) v1(58.72,73.46) v1(58.73,48.77) v1(58.84,86.58) v1(58.8,54.62) v1(58.75,47.43) v1(58.82,1.09) v1(58.89,4.72) v1(58.85,2.93) v1(59.01,6.35) v1(59.09,79.57) v1(59.13,52.18) v1(59.15,70.3) v1(59.15,56.7) v1(59.33,8.1) v1(59.39,23.51) v1(59.39,20.97) v1(59.4,18.55) v1(59.39,15.78) v1(59.39,13.24) v1(59.35,11.1) v1(59.47,45.9) v1(59.65,75.2) v1(59.83,126.09) v1(59.81,124.68) v1(59.83,123.19) v1(59.79,81.15) v1(60.04,121.63) v1(59.95,70.3) v1(59.95,56.7) v1(60,9.88) v1(60.12,117.13) v1(60.12,48.73) v1(60.13,44.11) v1(60.24,109.46) v1(60.24,106.92) v1(60.24,104.38) v1(60.26,114.55) v1(60.26,112.01) v1(60.44,119.72) v1(60.53,54.69) v1(60.59,72.81) v1(60.6,50.39) v1(60.62,42.34) v1(60.64,11.51) v1(60.65,83.22) v1(60.66,76.56) v1(60.74,52.8) v1(60.75,71.1) v1(60.75,55.9) v1(60.81,4.67) v1(60.84,0.95) v1(60.88,40.95) v1(60.87,6.28) v1(60.86,2.91) v1(60.96,118.17) v1(61,47.17) v1(61,35.59) v1(61.04,23.5) v1(61.19,74.26) v1(61.2,7.72) v1(61.32,98.33) v1(61.27,85.94) v1(61.32,13.18) v1(61.39,102.97) v1(61.44,91.37) v1(61.42,54.86) v1(61.6,116.58) v1(61.61,99.41) v1(61.55,80.27) v1(61.55,71.1) v1(61.55,55.9) v1(61.73,51.75) v1(61.69,15.73) v1(61.71,9.1) v1(61.81,126.07) v1(61.79,124.66) v1(61.81,123.17) v1(61.84,121.9) v1(61.76,43.62) v1(61.77,26.66) v1(61.91,77.72) v1(61.87,49.46) v1(61.87,20.93) v1(61.94,18.55) v1(61.9,14.8) v1(62.09,120.55) v1(62.09,25.29) v1(62.19,115.07) v1(62.16,39.6) v1(62.26,75.64) v1(62.34,24.01) v1(62.34,10.73) v1(62.35,71.1) v1(62.35,70.3) v1(62.35,63.9) v1(62.35,56.7) v1(62.35,55.9) v1(62.54,97.98) v1(62.52,16.25) v1(62.61,119.01) v1(62.59,101.64) v1(62.56,48.47) v1(62.67,113.86) v1(62.67,87.43) v1(62.78,109.46) v1(62.78,106.92) v1(62.78,104.38) v1(62.84,99.08) v1(62.79,83.97) v1(62.75,46.8) v1(62.78,22.71) v1(62.88,78.67) v1(62.94,45.19) v1(63.04,21.61) v1(63.02,12.4) v1(63.14,50.65) v1(63.13,17.73) v1(63.15,70.3) v1(63.15,63.9) v1(63.15,63.1) v1(63.15,56.7) v1(63.25,117.41) v1(63.33,112.26) v1(63.25,80.25) v1(63.34,20.31) v1(63.44,100.01) v1(63.37,76.57) v1(63.36,29.33) v1(63.49,82.47) v1(63.52,43.04) v1(63.6,27.17) v1(63.61,14.02) v1(63.73,101.45) v1(63.73,39.86) v1(63.66,28.19) v1(63.67,19.1) v1(63.94,115.73) v1(63.94,110.75) v1(63.85,36.69) v1(63.95,70.3) v1(63.95,69.5) v1(63.95,67.9) v1(63.95,66.3) v1(63.95,64.7) v1(63.95,62.3) v1(63.95,60.7) v1(63.95,59.1) v1(63.95,57.5) v1(63.95,56.7) v1(64.06,102.85) v1(64.11,87.19) v1(64.11,41.79) v1(64.05,25.74) v1(64.23,48.9) v1(64.23,15.47) v1(64.34,51.87) v1(64.28,10.45) v1(64.28,7.91) v1(64.28,5.37) v1(64.42,114.51) v1(64.4,24.53) v1(64.48,104.19) v1(64.53,78.17) v1(64.48,34.3) v1(64.55,85.14) v1(64.59,29.66) v1(64.72,109.08) v1(64.69,105.06) v1(64.68,12.92) v1(64.75,71.1) v1(64.75,68.7) v1(64.75,66.3) v1(64.75,63.9) v1(64.75,63.1) v1(64.75,60.7) v1(64.75,58.3) v1(64.75,55.9) v1(64.76,23.09) v1(64.84,16.95) v1(64.88,28.55) v1(64.97,106.1) v1(64.96,47.25) v1(65.01,22.18) v1(65.05,122.28) v1(65.05,119.74) v1(65.08,112.91) v1(65.24,99.56) v1(65.33,107.49) v1(65.38,79.7) v1(65.43,32.18) v1(65.44,20.82) v1(65.38,18.32) v1(65.59,111.58) v1(65.61,50.48) v1(65.56,1.26) v1(65.69,100.9) v1(65.67,45.74) v1(65.74,19.53) v1(66.05,117.65) v1(66.05,115.11) v1(66.11,102.21) v1(66.1,43.87) v1(66.05,26.57) v1(66.16,81.76) v1(66.31,42.4) v1(66.27,29.47) v1(66.34,17.95) v1(66.34,15.52) v1(66.37,109.92) v1(66.4,103.55) v1(66.57,37.07) v1(66.69,126.05) v1(66.65,104.45) v1(66.73,84.55) v1(66.67,23.93) v1(66.82,10.45) v1(66.82,7.91) v1(66.82,5.37) v1(66.82,3.09) v1(66.85,96.85) v1(66.98,108.32) v1(67.03,105.74) v1(66.96,89.89) v1(67.13,97.93) v1(67.22,12.92) v1(67.36,107.1) v1(67.38,28.28) v1(67.35,21.05) v1(67.45,47.8) v1(67.59,122.28) v1(67.59,119.74) v1(67.66,40.85) v1(67.73,26.8) v1(67.91,124.35) v1(68.01,25.49) v1(68.07,96.5) v1(68.11,86.15) v1(68.1,1.26) v1(68.36,97.6) v1(68.41,24.21) v1(68.62,78.85) v1(68.69,81) v1(68.71,23.13) v1(68.88,30.81) v1(68.88,21.75) v1(68.91,17.99) v1(68.91,15.55) v1(69.04,45.01) v1(68.99,28.7) v1(69.08,98.5) v1(69.23,126.05) v1(69.18,29.67) v1(69.28,20.47) v1(69.39,99.91) v1(69.39,10.48) v1(69.5,7.87) v1(69.5,5.33) v1(69.57,27.22) v1(69.7,101.26) v1(69.69,50.3) v1(69.68,19.24) v1(69.79,12.96) v1(69.88,111.7) v1(69.88,109.16) v1(69.86,106.35) v1(69.91,40.89) v1(69.85,25.93) v1(69.99,47.8) v1(70.13,122.28) v1(70.13,119.74) v1(70.12,102.63) v1(70.11,31.14) v1(70.1,17.56) v1(70.28,63.42) v1(70.28,24.57) v1(70.36,103.64) v1(70.4,30.03) v1(70.52,104.78) v1(70.51,55.32) v1(70.53,23.66) v1(70.48,16.1) v1(70.64,117.65) v1(70.64,115.11) v1(70.64,98.05) v1(70.59,43.31) v1(70.84,14.55) v1(70.94,22.33) v1(70.99,106.29) v1(71.1,78.88) v1(71.21,99.42) v1(71.18,81.04) v1(71.24,21.01) v1(71.22,13.09) v1(71.37,107.92) v1(71.37,88.85) v1(71.37,86.31) v1(71.39,35.12) v1(71.49,100.76) v1(71.45,83.52) v1(71.46,19.7) v1(71.55,46.1) v1(71.56,11.65) v1(71.65,26.8) v1(71.75,109.88) v1(71.92,102.07) v1(71.88,18.02) v1(71.94,10.2) v1(72.07,73.12) v1(72.12,41.76) v1(72.15,111.72) v1(72.17,102.97) v1(72.19,75.8) v1(72.21,62.33) v1(72.26,43.51) v1(72.26,16.56) v1(72.3,8.68) v1(72.36,53.31) v1(72.56,113.77) v1(72.58,104.33) v1(72.62,15.01) v1(72.69,50.09) v1(72.66,6.96) v1(72.81,2.97) v1(72.82,1.08) v1(72.93,115.61) v1(72.88,105.62) v1(72.88,5.2) v1(72.97,63.88) v1(73.03,38.13) v1(72.99,13.55) v1(73.13,46.74) v1(73.08,44.55) v1(73.13,35.34) v1(73.24,117.36) v1(73.15,107.54) v1(73.2,55.6) v1(73.28,60.83) v1(73.33,25.45) v1(73.33,12.11) v1(73.36,75.36) v1(73.52,119.18) v1(73.53,109.5) v1(73.53,23.08) v1(73.49,20.3) v1(73.61,28.59) v1(73.57,17.82) v1(73.68,120.79) v1(73.69,101.61) v1(73.73,99.1) v1(73.73,96.56) v1(73.73,94.02) v1(73.71,10.66) v1(73.79,126.07) v1(73.78,124.66) v1(73.79,123.17) v1(73.79,122.1) v1(73.77,91.39) v1(73.77,88.85) v1(73.77,86.31) v1(73.93,111.34) v1(73.85,104.07) v1(73.93,83.55) v1(74.07,9.14) v1(74.33,39.52) v1(74.35,113.39) v1(74.42,71.4) v1(74.37,59.23) v1(74.43,7.42) v1(74.55,65.3) v1(74.71,115.22) v1(74.71,5.3) v1(74.81,2.93) v1(74.79,1.06) v1(75.03,116.98) v1(75.03,56.11) v1(74.95,31.51) v1(74.97,14.35) v1(75.08,47.78) v1(75.3,118.8) v1(75.29,42.32) v1(75.33,11.47) v1(75.44,44.42) v1(75.46,120.41) v1(75.58,121.71) v1(75.62,50.09) v1(75.61,8.83) v1(75.67,35.34) v1(75.81,126.02) v1(75.79,124.61) v1(75.81,123.12) v1(75.95,77.83) v1(76,73.02) v1(75.97,69.93) v1(76.02,68.4) v1(75.97,66.88) v1(76.02,65.41) v1(75.97,63.86) v1(76,62.26) v1(76,60.78) v1(76,57.71) v1(75.97,54.71) v1(76,51.79) v1(76.05,71.5) v1(76.1,59.33) v1(76.1,56.31) v1(76.07,53.37) v1(76.07,23.08) v1(76.2,33.02) v1(76.18,28.62) v1(76.2,25.4) v1(76.2,20.32) v1(76.2,17.78) v1(76.28,109.16) v1(76.28,106.62) v1(76.28,104.08) v1(76.32,101.57) v1(76.32,99.03) v1(76.32,96.49) v1(76.25,86.34) v1(76.28,74.6) v1(76.4,121.87) v1(76.4,119.33) v1(76.4,116.79) v1(76.4,114.25) v1(76.4,111.71) v1(76.36,93.87) v1(76.36,91.33) v1(76.36,88.79) v1(76.68,39.52) v1(76.73,6.24) v1(77.34,75.64) v1(77.34,42.6) v1(77.37,80.62) v1(77.37,78.28) v1(77.42,48.23) v1(77.39,45.42) v1(77.6,14.31) v1(77.98,50.11) v1(77.96,11.43) v1(78.24,8.79) v1(78.54,39.07) v1(78.74,86.36) v1(78.74,25.4) v1(78.74,22.86) v1(78.74,20.32) v1(78.74,17.78) v1(78.82,109.16) v1(78.82,106.62) v1(78.82,104.08) v1(78.77,83.79) v1(78.82,37.36) v1(78.94,121.87) v1(78.94,119.33) v1(78.94,116.79) v1(78.94,114.25) v1(78.94,111.71) v1(78.86,101.57) v1(78.86,99.03) v1(78.86,96.49) v1(78.9,93.87) v1(78.9,91.33) v1(78.9,88.79) v1(78.89,74.63) v1(78.92,73.02) v1(78.88,35.34) v1(78.99,71.55) v1(79.02,69.98) v1(78.99,68.45) v1(79.04,66.95) v1(78.97,51.74) v1(78.97,40.89) v1(79.07,65.41) v1(79.1,63.83) v1(79.1,62.36) v1(79.07,60.81) v1(79.1,59.28) v1(79.1,57.76) v1(79.07,50.14) v1(79.15,56.21) v1(79.17,54.76) v1(79.17,53.26) v1(79.48,46.28) v1(79.56,77.06) v1(80.01,43.21) v1(80.12,1.17) v1(80.24,47.65) v1(80.43,79.57) v1(80.39,13.49) v1(80.54,50.14) v1(80.67,74.65) v1(80.7,73.05) v1(80.77,71.58) v1(80.8,70) v1(80.77,68.48) v1(80.82,66.98) v1(80.9,125.93) v1(80.85,65.43) v1(80.87,63.86) v1(80.87,62.33) v1(80.85,60.83) v1(80.87,59.31) v1(80.87,57.78) v1(80.92,56.24) v1(80.92,54.71) v1(80.95,53.29) v1(81.2,51.92) v1(81.15,41.33) v1(81.28,86.36) v1(81.28,83.82) v1(81.25,46.35) v1(81.36,109.16) v1(81.36,106.62) v1(81.36,104.08) v1(81.4,101.57) v1(81.4,99.03) v1(81.4,96.49) v1(81.44,93.87) v1(81.44,91.33) v1(81.44,88.79) v1(81.41,77.03) v1(81.42,35.34) v1(81.48,121.87) v1(81.48,119.33) v1(81.48,116.79) v1(81.48,114.25) v1(81.48,111.71) v1(81.99,39.65) v1(82.08,3.12) v1(82.26,124.31) v1(82.35,16.99) v1(82.45,54.71) v1(82.73,74.57) v1(82.73,73) v1(82.83,71.5) v1(82.83,68.4) v1(82.75,1.13) v1(82.92,79.6) v1(82.85,69.93) v1(82.88,66.9) v1(82.91,65.35) v1(82.93,63.83) v1(82.93,62.31) v1(82.91,60.81) v1(82.93,59.23) v1(82.93,57.71) v1(82.98,56.16) v1(83.01,53.21) v1(82.96,47.7) v1(83.08,51.87) v1(83.06,50.11) v1(83.08,46.05) v1(83.13,43.36) v1(83.11,42.67) v1(83.11,39.93) v1(83.13,39.37) v1(83.13,36.58) v1(83.35,125.92) v1(83.67,78.05) v1(83.82,121.92) v1(83.82,119.38) v1(83.82,116.84) v1(83.82,114.3) v1(83.82,111.76) v1(83.82,109.22) v1(83.82,106.68) v1(83.82,99.06) v1(83.82,96.52) v1(83.82,82.55) v1(83.82,5.08) v1(83.91,104.2) v1(83.97,101.59) v1(84.02,9.63) v1(84.11,35.3) v1(84.15,46.53) v1(84.66,54.89) v1(84.71,3.08) v1(84.76,73) v1(84.79,7.83) v1(84.86,124.33) v1(84.86,71.5) v1(84.89,69.93) v1(84.86,68.4) v1(84.91,66.9) v1(84.94,65.35) v1(84.94,60.81) v1(84.86,48.23) v1(84.96,63.83) v1(84.96,62.31) v1(84.96,59.23) v1(84.96,57.71) v1(85.01,56.16) v1(85.12,51.87) v1(85.09,50.11) v1(85.09,41.91) v1(85.12,15.9) v1(85.16,1.09) v1(85.56,125.87) v1(85.67,39.8) v1(85.83,37.06) v1(85.88,44.83) v1(86.2,104.18) v1(86.16,47.02) v1(86.34,101.62) v1(86.36,121.92) v1(86.36,119.38) v1(86.36,116.84) v1(86.36,114.3) v1(86.36,111.76) v1(86.36,109.22) v1(86.36,106.68) v1(86.36,99.06) v1(86.36,96.52) v1(86.36,82.55) v1(86.36,5.08) v1(86.56,54.89) v1(86.61,44.09) v1(86.66,73) v1(86.65,35.3) v1(86.77,71.5) v1(86.79,69.93) v1(86.77,68.4) v1(86.82,66.9) v1(86.84,65.35) v1(86.84,60.81) v1(86.82,50.14) v1(86.91,124.33) v1(86.87,63.83) v1(86.87,62.31) v1(86.87,59.23) v1(86.92,56.16) v1(86.94,53.21) v1(86.89,48.23) v1(87.3,125.88) v1(87.33,7.83) v1(87.53,51.89) v1(87.45,1.22) v1(87.74,15.86) v1(87.99,57.89) v1(88.24,94.01) v1(88.19,47.02) v1(88.16,39.8) v1(88.29,91.97) v1(88.32,44.81) v1(88.29,42.37) v1(88.37,37.06) v1(88.47,54.89) v1(88.57,73) v1(88.62,48.26) v1(88.74,104.36) v1(88.72,86.56) v1(88.67,84.56) v1(88.67,71.5) v1(88.7,69.93) v1(88.67,68.4) v1(88.72,66.9) v1(88.75,65.35) v1(88.77,63.83) v1(88.8,62.28) v1(88.77,59.23) v1(88.9,124.46) v1(88.9,121.92) v1(88.9,119.38) v1(88.9,116.84) v1(88.9,114.3) v1(88.9,111.76) v1(88.9,109.22) v1(88.9,106.68) v1(88.85,101.72) v1(88.9,99.06) v1(88.9,96.52) v1(88.85,53.21) v1(88.93,51.87) v1(88.9,2.54) v1(89.08,44.09) v1(89.23,57.91) v1(89.26,50.14) v1(89.26,41.43) v1(89.42,35.18) v1(89.51,125.83) v1(89.61,93.98) v1(89.61,91.8) v1(89.61,60.93) v1(89.66,56.16) v1(89.87,87.48) v1(89.92,47.04) v1(90.04,102.69) v1(89.99,1.22) v1(90.14,63.86) v1(90.22,57.94) v1(90.17,53.19) v1(90.27,85.12) v1(90.3,62.26) v1(90.35,51.89) v1(90.35,44.81) v1(90.35,39.78) v1(90.47,73) v1(90.58,71.5) v1(90.6,69.93) v1(90.58,68.4) v1(90.63,66.9) v1(90.7,89.87) v1(90.73,56.16) v1(90.91,93.12) v1(90.88,54.94) v1(90.91,37.06) v1(91.03,65.33) v1(90.98,60.99) v1(91.11,94.72) v1(91.14,86.16) v1(91.11,44.09) v1(91.24,50.11) v1(91.19,48.23) v1(91.16,42.42) v1(91.44,121.92) v1(91.44,119.38) v1(91.44,116.84) v1(91.44,114.3) v1(91.44,111.76) v1(91.44,109.22) v1(91.41,59.26) v1(91.44,5.08) v1(91.44,2.54) v1(91.52,51.87) v1(91.64,62.26) v1(91.67,96.27) v1(91.82,75.59) v1(91.8,41.45) v1(91.85,83.77) v1(91.95,56.16) v1(91.96,35.18) v1(92.04,17.41) v1(92.1,54.91) v1(92.18,44.78) v1(92.38,73) v1(92.41,64.01) v1(92.48,71.5) v1(92.51,69.93) v1(92.48,68.4) v1(92.51,46.91) v1(92.53,1.22) v1(92.58,59.23) v1(92.71,93.47) v1(92.68,65.35) v1(92.71,57.91) v1(92.66,53.21) v1(92.67,23.99) v1(92.67,21.45) v1(92.84,39.78) v1(92.89,60.99) v1(92.86,44.09) v1(93.04,89.46) v1(92.99,88.27) v1(93.14,50.11) v1(93.07,42.42) v1(93.17,48.21) v1(93.27,54.91) v1(93.4,67.08) v1(93.52,103.17) v1(93.45,37.06) v1(93.6,93.32) v1(93.73,106.07) v1(93.7,95.45) v1(93.7,41.45) v1(93.75,96.34) v1(93.8,69.95) v1(93.98,121.92) v1(93.98,119.38) v1(93.98,116.84) v1(93.98,114.3) v1(93.98,111.76) v1(93.98,109.22) v1(93.98,68.4) v1(93.98,25.4) v1(93.98,5.08) v1(93.98,2.54) v1(94.11,76.81) v1(94.08,63.98) v1(94.13,62.26) v1(94.21,102.41) v1(94.23,91.41) v1(94.23,89.53) v1(94.31,107.34) v1(94.28,73) v1(94.34,57.89) v1(94.39,71.5) v1(94.49,59.23) v1(94.54,56.16) v1(94.49,46.89) v1(94.56,53.21) v1(94.64,51.87) v1(94.69,44.83) v1(94.84,93.29) v1(94.84,91.41) v1(94.84,89.53) v1(94.84,87.66) v1(94.81,35.18) v1(94.92,125.98) v1(94.92,124.71) v1(94.92,123.37) v1(94.92,122) v1(94.92,119.38) v1(94.87,67.11) v1(94.97,120.73) v1(94.97,118.01) v1(94.97,116.87) v1(94.97,42.32) v1(95.07,48.21) v1(95.07,18.8) v1(95.07,16.26) v1(95.07,1.22) v1(95.17,65.35) v1(95.28,115.44) v1(95.25,108.31) v1(95.25,68.4) v1(95.28,44.15) v1(95.3,39.78) v1(95.4,60.99) v1(95.45,106.15) v1(95.5,95.17) v1(95.5,93.29) v1(95.61,41.45) v1(95.68,82.88) v1(95.71,54.91) v1(95.68,50.14) v1(95.78,62.28) v1(95.99,76.86) v1(95.96,70.15) v1(96.01,57.91) v1(95.99,37.06) v1(96.14,105.36) v1(96.22,109.3) v1(96.19,73) v1(96.27,114.17) v1(96.32,106.98) v1(96.29,71.5) v1(96.29,51.87) v1(96.44,56.16) v1(96.39,46.89) v1(96.37,44.81) v1(96.52,67.11) v1(96.52,25.4) v1(96.52,7.62) v1(96.52,5.08) v1(96.52,2.54) v1(96.55,64.01) v1(96.67,102.34) v1(96.7,50.14) v1(96.77,125.93) v1(96.77,124.66) v1(96.77,123.32) v1(96.77,121.95) v1(96.82,120.68) v1(96.77,119.33) v1(96.77,118.06) v1(96.82,65.38) v1(96.83,15.36) v1(96.83,12.82) v1(96.85,116.92) v1(96.94,110.76) v1(96.92,107.99) v1(96.88,81.71) v1(96.95,116.2) v1(96.98,113.06) v1(97,111.79) v1(97.04,84.42) v1(96.98,80.62) v1(96.95,44.12) v1(97.03,42.34) v1(97.08,106.5) v1(97.08,105.21) v1(97.1,104.42) v1(97.08,60.99) v1(97.08,59.28) v1(97.43,70.13) v1(97.43,53.16) v1(97.35,35.18) v1(97.61,54.91) v1(97.61,1.22) v1(97.74,115.27) v1(97.66,71.48) v1(97.66,41.38) v1(97.79,56.16) v1(97.79,39.78) v1(97.99,76.81) v1(98.02,47.8) v1(98.07,50.11) v1(98.15,79.55) v1(98.2,68.4) v1(98.2,64.01) v1(98.27,65.35) v1(98.3,62.23) v1(98.27,44.81) v1(98.35,100.28) v1(98.38,83.08) v1(98.37,73.2) v1(98.48,57.91) v1(98.53,37.06) v1(98.6,114.15) v1(98.73,106.5) v1(98.68,105.21) v1(98.73,51.89) v1(98.83,113.08) v1(98.78,107.95) v1(98.83,59.28) v1(98.86,111.91) v1(98.91,109.25) v1(98.86,53.19) v1(98.86,44.12) v1(98.93,42.34) v1(99.03,70.13) v1(99.01,67.11) v1(99.03,54.91) v1(99.06,120.65) v1(99.06,118.11) v1(99.14,103.38) v1(99.06,30.48) v1(99.06,27.94) v1(99.06,25.4) v1(99.06,7.62) v1(99.06,5.08) v1(99.06,2.54) v1(99.16,102.23) v1(99.21,46.63) v1(99.31,83.57) v1(99.31,81.69) v1(99.37,15.36) v1(99.37,12.82) v1(99.57,60.99) v1(99.57,41.38) v1(99.64,39.78) v1(99.69,63.98) v1(99.77,78.23) v1(99.85,110.77) v1(99.9,73.18) v1(99.87,62.26) v1(99.9,48.23) v1(99.92,35.06) v1(99.95,113.06) v1(100.03,44.86) v1(100.1,71.5) v1(100.1,68.4) v1(100.23,99.01) v1(100.23,57.89) v1(100.15,1.22) v1(100.25,56.16) v1(100.43,106.58) v1(100.43,105.41) v1(100.36,51.87) v1(100.51,67.08) v1(100.48,50.14) v1(100.63,79.86) v1(100.56,46.61) v1(100.79,65.35) v1(100.76,53.19) v1(100.76,44.12) v1(100.84,42.34) v1(100.91,111.81) v1(101.04,60.99) v1(101.12,114.15) v1(101.19,83.57) v1(101.19,81.69) v1(101.27,59.23) v1(101.27,37.03) v1(101.37,84.2) v1(101.37,62.26) v1(101.42,54.94) v1(101.4,49.17) v1(101.47,70.13) v1(101.47,41.38) v1(101.6,125.73) v1(101.6,123.19) v1(101.6,120.65) v1(101.6,118.11) v1(101.63,39.8) v1(101.6,33.02) v1(101.6,30.48) v1(101.6,27.94) v1(101.6,25.4) v1(101.6,17.78) v1(101.6,10.16) v1(101.6,7.62) v1(101.6,5.08) v1(101.6,2.54) v1(101.78,47.4) v1(101.93,56.13) v1(101.93,44.86) v1(101.94,15.39) v1(101.96,81.56) v1(102.01,71.5) v1(102.04,12.78) v1(102.06,112.88) v1(102.08,73.2) v1(102.06,67.08) v1(102.08,65.35) v1(102.13,63.98) v1(102.18,114.45) v1(102.24,50.11) v1(102.26,51.87) v1(102.36,104.67) v1(102.39,80.11) v1(102.46,46.61) v1(102.46,35.06) v1(102.57,103.38) v1(102.57,99.62) v1(102.57,97.74) v1(102.62,60.99) v1(102.62,57.91) v1(102.67,44.12) v1(102.74,42.34) v1(102.69,1.22) v1(102.82,59.26) v1(103,49.17) v1(103.17,105.64) v1(103.2,68.4) v1(103.15,54.91) v1(103.17,53.16) v1(103.38,70.13) v1(103.38,41.38) v1(103.5,114.43) v1(103.5,73.23) v1(103.5,71.48) v1(103.53,64.01) v1(103.56,112.9) v1(103.68,47.4) v1(103.76,65.38) v1(103.84,44.86) v1(103.86,62.26) v1(103.94,57.91) v1(104.14,125.73) v1(104.14,123.19) v1(104.14,120.65) v1(104.14,118.11) v1(104.14,50.11) v1(104.14,35.56) v1(104.14,33.02) v1(104.14,25.4) v1(104.14,2.54) v1(104.24,19.86) v1(104.29,68.4) v1(104.34,56.16) v1(104.44,103.38) v1(104.44,99.62) v1(104.44,97.74) v1(104.37,79.96) v1(104.42,67.13) v1(104.37,59.26) v1(104.37,46.61) v1(104.52,51.89) v1(104.57,53.16) v1(104.57,44.12) v1(104.9,49.17) v1(105.03,114.4) v1(105.03,103.81) v1(104.98,71.48) v1(105.08,112.85) v1(105.13,73.2) v1(105.08,64.01) v1(105.13,61.01) v1(105.23,1.22) v1(105.33,62.26) v1(105.44,84.12) v1(105.44,83.52) v1(105.38,47.45) v1(105.49,68.38) v1(105.46,36.96) v1(105.64,54.89) v1(105.74,57.89) v1(105.74,44.86) v1(105.84,70.1) v1(105.97,56.16) v1(105.99,53.21) v1(106.05,50.11) v1(106.12,65.41) v1(106.07,51.87) v1(106.07,46.66) v1(106.3,112.9) v1(106.38,67.13) v1(106.5,114.43) v1(106.5,98.02) v1(106.48,44.12) v1(106.63,41.55) v1(106.68,125.73) v1(106.68,123.19) v1(106.68,120.65) v1(106.68,118.11) v1(106.73,73.2) v1(106.68,35.56) v1(106.68,33.02) v1(106.68,2.54) v1(106.81,98.78) v1(106.76,60.99) v1(106.81,49.17) v1(106.93,77.39) v1(106.91,75.44) v1(106.86,62.28) v1(106.86,59.23) v1(107,112.53) v1(107.34,95.83) v1(107.31,83.52) v1(107.31,71.48) v1(107.29,70.13) v1(107.29,47.45) v1(107.31,37.46) v1(107.54,54.89) v1(107.72,68.4) v1(107.65,44.86) v1(107.77,67.11) v1(107.8,65.35) v1(107.82,64.01) v1(107.77,1.22) v1(107.87,56.16) v1(107.9,53.21) v1(107.95,102.87) v1(107.95,99.06) v1(107.98,95.83) v1(107.98,51.87) v1(107.95,50.11) v1(107.98,46.66) v1(108.13,42.29) v1(108.15,60.96) v1(108.2,57.89) v1(108.25,86.94) v1(108.31,59.23) v1(108.38,44.12) v1(108.71,71.45) v1(108.71,49.17) v1(108.81,75.44) v1(108.86,41.55) v1(109.04,73.2) v1(109.09,84.28) v1(109.22,125.73) v1(109.22,123.19) v1(109.22,120.65) v1(109.22,118.11) v1(109.19,47.45) v1(109.22,35.56) v1(109.22,33.02) v1(109.22,2.54) v1(109.37,88.82) v1(109.37,86.94) v1(109.45,54.89) v1(109.6,70.15) v1(109.63,68.4) v1(109.55,44.86) v1(109.7,77.47) v1(109.68,67.11) v1(109.7,65.35) v1(109.73,64.01) v1(109.73,62.31) v1(109.73,59.23) v1(109.78,56.16) v1(109.8,53.21) v1(109.93,79.63) v1(109.88,51.87) v1(109.86,50.11) v1(109.88,46.66) v1(109.86,37.46) v1(110.03,95.99) v1(110.03,90.35) v1(109.96,80.98) v1(110.03,42.29) v1(110.11,57.89) v1(110.29,44.12) v1(110.31,1.22) v1(110.54,110.08) v1(110.49,105.41) v1(110.62,60.99) v1(110.62,49.17) v1(110.77,41.55) v1(111,103.3) v1(111.02,101.3) v1(111,84.28) v1(111.1,47.45) v1(111.2,75.34) v1(111.33,73.51) v1(111.35,54.89) v1(111.43,10.43) v1(111.51,108.64) v1(111.53,71.5) v1(111.51,70.15) v1(111.53,68.4) v1(111.61,77.47) v1(111.58,67.11) v1(111.61,65.35) v1(111.63,64.01) v1(111.63,62.31) v1(111.63,59.23) v1(111.61,44.88) v1(111.68,56.16) v1(111.71,53.21) v1(111.76,125.73) v1(111.76,123.19) v1(111.81,110.31) v1(111.84,79.63) v1(111.79,51.87) v1(111.76,50.11) v1(111.79,46.66) v1(111.76,35.56) v1(111.76,33.02) v1(111.76,30.48) v1(111.76,27.94) v1(111.76,7.62) v1(111.76,5.08) v1(111.76,2.54) v1(111.86,80.98) v1(111.91,60.99) v1(111.94,42.29) v1(111.96,108.12) v1(112.01,57.89) v1(112.29,74.63) v1(112.29,44.09) v1(112.39,107.69) v1(112.4,37.46) v1(112.52,49.17) v1(112.67,41.55) v1(112.82,107.26) v1(112.87,111.37) v1(112.85,1.22) v1(113.03,120.65) v1(113,47.45) v1(113.21,117.98) v1(113.23,73.51) v1(113.26,54.89) v1(113.36,108.33) v1(113.44,71.5) v1(113.41,70.15) v1(113.44,68.4) v1(113.41,60.93) v1(113.46,92.18) v1(113.51,90.4) v1(113.51,77.47) v1(113.49,67.11) v1(113.51,65.35) v1(113.54,64.01) v1(113.54,62.31) v1(113.54,59.23) v1(113.51,44.88) v1(113.56,122.35) v1(113.59,56.16) v1(113.61,53.21) v1(113.72,101.07) v1(113.74,79.63) v1(113.69,51.87) v1(113.66,50.11) v1(113.69,46.66) v1(113.77,80.98) v1(113.84,42.29) v1(113.92,94.01) v1(113.92,57.89) v1(114.1,112.65) v1(114.2,74.63) v1(114.2,44.09) v1(114.3,125.73) v1(114.3,35.56) v1(114.3,7.62) v1(114.3,5.08) v1(114.3,2.54) v1(114.43,49.17) v1(114.39,20.26) v1(114.55,89.56) v1(114.58,41.55) v1(114.83,91.69) v1(114.91,47.45) v1(114.94,37.46) v1(115.14,73.51) v1(115.16,54.89) v1(115.34,71.5) v1(115.32,70.15) v1(115.34,68.4) v1(115.32,60.93) v1(115.42,77.47) v1(115.39,67.11) v1(115.42,65.35) v1(115.44,64.01) v1(115.44,62.31) v1(115.44,59.23) v1(115.42,44.88) v1(115.39,1.22) v1(115.49,56.16) v1(115.52,53.21) v1(115.57,120.65) v1(115.6,88.29) v1(115.6,86.39) v1(115.6,84.48) v1(115.6,82.58) v1(115.6,51.87) v1(115.57,50.11) v1(115.6,46.66) v1(115.67,92.25) v1(115.67,80.98) v1(115.65,79.63) v1(115.77,74.93) v1(115.82,57.89) v1(115.75,42.29) v1(116,90.45) v1(116.1,44.09) v1(116.33,49.17) v1(116.48,41.55) v1(116.84,125.73) v1(116.81,47.45) v1(116.84,35.56) v1(116.84,5.08) v1(116.84,2.54) v1(117.04,89.41) v1(117.04,73.51) v1(117.07,54.89) v1(117.22,70.15) v1(117.22,60.93) v1(117.3,82.96) v1(117.32,77.47) v1(117.25,71.5) v1(117.25,68.4) v1(117.3,67.11) v1(117.32,65.35) v1(117.32,44.88) v1(117.4,92.28) v1(117.35,84.58) v1(117.42,75.31) v1(117.35,64.01) v1(117.35,62.31) v1(117.35,59.23) v1(117.4,56.16) v1(117.42,53.21) v1(117.5,51.87) v1(117.47,50.11) v1(117.5,46.66) v1(117.47,37.46) v1(117.58,80.98) v1(117.55,79.63) v1(117.73,57.89) v1(117.65,42.29) v1(118.01,112.57) v1(117.98,88.52) v1(118.01,44.09) v1(118.11,120.65) v1(118.24,49.17) v1(118.26,109.19) v1(118.39,118.01) v1(118.39,74.5) v1(118.39,41.55) v1(118.72,47.45) v1(118.95,73.51) v1(118.97,54.89) v1(119.13,70.15) v1(119.13,60.93) v1(119.15,96.01) v1(119.2,82.96) v1(119.23,77.47) v1(119.15,71.5) v1(119.15,68.4) v1(119.2,67.11) v1(119.23,65.35) v1(119.23,44.88) v1(119.28,92.28) v1(119.25,84.58) v1(119.25,64.01) v1(119.25,62.31) v1(119.25,59.23) v1(119.3,56.16) v1(119.33,53.21) v1(119.38,125.73) v1(119.38,102.87) v1(119.41,51.87) v1(119.38,50.11) v1(119.41,46.66) v1(119.38,35.56) v1(119.38,33.02) v1(119.38,17.78) v1(119.48,80.98) v1(119.46,79.63) v1(119.63,57.89) v1(119.58,7.72) v1(119.71,42.32) v1(119.76,86.74) v1(119.91,44.09) v1(120.02,37.46) v1(120.14,49.17) v1(120.29,74.5) v1(120.4,41.53) v1(120.62,47.45) v1(120.68,122.35) v1(120.65,120.65) v1(120.78,54.97) v1(120.85,73.51) v1(121.03,70.15) v1(121.03,60.93) v1(121.13,77.47) v1(121.06,71.5) v1(121.06,68.4) v1(121.11,67.11) v1(121.13,65.35) v1(121.13,44.88) v1(121.16,64.01) v1(121.16,62.31) v1(121.16,59.23) v1(121.21,56.16) v1(121.23,53.21) v1(121.23,9.75) v1(121.31,51.87) v1(121.28,50.11) v1(121.31,46.66) v1(121.39,80.98) v1(121.36,79.63) v1(121.54,57.89) v1(121.56,96.01) v1(121.56,84.89) v1(121.62,42.32) v1(121.82,44.09) v1(121.92,125.73) v1(121.92,33.02) v1(121.92,30.48) v1(121.92,7.62) v1(122.05,75.31) v1(122.05,49.17) v1(122.3,41.53) v1(122.53,47.45) v1(122.56,37.46) v1(122.68,54.97) v1(122.76,73.51) v1(122.94,70.15) v1(122.94,60.93) v1(123.04,77.47) v1(122.96,71.5) v1(122.96,68.4) v1(123.01,67.11) v1(123.04,65.35) v1(123.04,44.88) v1(123.01,1.22) v1(123.06,64.01) v1(123.06,62.31) v1(123.06,59.23) v1(123.11,56.16) v1(123.14,53.21) v1(123.19,120.65) v1(123.16,114.91) v1(123.19,102.87) v1(123.22,51.87) v1(123.19,50.11) v1(123.22,46.66) v1(123.27,79.63) v1(123.39,75.31) v1(123.44,57.89) v1(123.52,42.32) v1(123.47,22.78) v1(123.72,44.09) v1(123.98,112.6) v1(123.95,49.17) v1(124.13,82.4) v1(124.21,41.53) v1(124.43,47.45) v1(124.46,125.73) v1(124.46,20.32) v1(124.46,5.08) v1(124.46,2.54) v1(124.59,54.97) v1(124.66,73.51) v1(124.79,74.5) v1(124.84,70.15) v1(124.84,60.93) v1(124.94,77.47) v1(124.87,71.5) v1(124.87,68.4) v1(124.92,67.11) v1(124.94,65.35) v1(124.94,44.88) v1(124.97,64.01) v1(124.97,62.31) v1(124.97,59.23) v1(125.02,56.16) v1(125.04,53.21) v1(125.12,51.87) v1(125.09,50.11) v1(125.12,46.66) v1(125.09,37.46) v1(125.17,79.63) v1(125.3,117.96) v1(125.35,57.89) v1(125.43,42.32) v1(125.4,1.18) v1(125.48,102.87) v1(125.6,93.19) v1(125.63,44.09) v1(125.86,49.17) v1(126.11,41.53) v1(126.34,47.45) v1(126.49,54.97) v1(126.57,73.51) v1(126.7,74.5) v1(126.77,71.5) v1(126.75,70.15) v1(126.77,68.4) v1(126.82,67.11) v1(126.75,60.93) v1(126.85,77.47) v1(126.85,65.35) v1(126.87,64.01) v1(126.87,62.31) v1(126.87,59.23) v1(126.92,56.16) v1(126.85,44.88) v1(127,125.73) v1(127,120.65) v1(126.95,53.21) v1(127.03,51.87) v1(127,50.11) v1(127.03,46.66) v1(127,33.02) v1(127,20.32) v1(127,17.78) v1(127,2.54) v1(127.08,79.63) v1(127.23,82.17) v1(127.25,57.89) v1(127.33,42.32) v1(127.53,44.09) v1(127.63,37.46) v1(127.76,49.17) v1(127.94,1.18) v1(128.02,122.17) v1(128.04,75.31) v1(127.97,47.45) v1(128.02,41.53) v1(128.02,21.14) v1(128.14,93.19) v1(128.4,102.74) v1(128.4,54.97) v1(128.47,73.51) v1(128.68,71.5) v1(128.65,70.15) v1(128.68,68.4) v1(128.73,67.11) v1(128.65,60.93) v1(128.65,46.66) v1(128.83,82.17) v1(128.75,77.47) v1(128.75,65.35) v1(128.78,64.01) v1(128.78,62.31) v1(128.78,59.23) v1(128.83,56.16) v1(128.75,44.88) v1(128.85,53.21) v1(128.93,51.87) v1(128.91,50.11) v1(129.03,97.59) v1(128.98,79.63) v1(129.16,57.89) v1(129.24,42.32) v1(129.36,75.31) v1(129.44,44.09) v1(129.54,125.73) v1(129.54,35.56) v1(129.54,33.02) v1(129.54,17.78) v1(129.54,2.54) v1(129.67,49.17) v1(129.87,47.45) v1(129.92,41.53) v1(130.18,37.46) v1(130.3,54.97) v1(130.38,73.51) v1(130.56,93.19) v1(130.58,71.5) v1(130.56,70.15) v1(130.58,68.4) v1(130.63,67.11) v1(130.56,60.93) v1(130.56,46.66) v1(130.63,1.22) v1(130.71,102.82) v1(130.66,77.47) v1(130.66,65.35) v1(130.68,64.01) v1(130.68,62.31) v1(130.68,59.23) v1(130.73,56.16) v1(130.66,44.88) v1(130.81,120.65) v1(130.76,111.94) v1(130.76,53.21) v1(130.84,51.87) v1(130.81,50.11) v1(130.89,79.63) v1(130.89,74.5) v1(130.92,15.31) v1(131.03,19.99) v1(130.96,13.95) v1(131.06,57.89) v1(131.14,42.32) v1(131.34,44.09) v1(131.57,49.17) v1(131.78,47.45) v1(131.83,41.53) v1(131.9,82.19) v1(132.03,114.78) v1(131.95,19.99) v1(132.08,125.73) v1(132.08,30.48) v1(132.08,5.08) v1(132.08,2.54) v1(132.21,54.97) v1(132.28,73.51) v1(132.54,118.19) v1(132.49,71.5) v1(132.46,70.15) v1(132.49,68.4) v1(132.54,67.11) v1(132.46,60.93) v1(132.46,46.66) v1(132.56,77.47) v1(132.56,65.35) v1(132.59,64.01) v1(132.59,62.31) v1(132.59,59.23) v1(132.64,56.16) v1(132.56,44.88) v1(132.61,6.65) v1(132.66,53.21) v1(132.74,51.87) v1(132.72,50.11) v1(132.72,37.46) v1(132.82,79.63) v1(132.79,74.5) v1(132.97,57.89) v1(133.1,93.19) v1(133.05,42.32) v1(133.22,102.9) v1(133.17,1.22) v1(133.25,44.09) v1(133.35,120.65) v1(133.45,111.86) v1(133.48,49.17) v1(133.68,47.45) v1(133.73,41.53) v1(134.04,75.26) v1(134.11,54.97) v1(134.19,73.51) v1(134.39,71.5) v1(134.39,68.4) v1(134.44,67.11) v1(134.37,60.93) v1(134.37,46.66) v1(134.43,10.19) v1(134.43,7.65) v1(134.43,5) v1(134.43,2.46) v1(134.47,77.47) v1(134.47,65.35) v1(134.49,64.01) v1(134.49,62.31) v1(134.49,59.23) v1(134.54,56.16) v1(134.47,44.88) v1(134.62,125.73) v1(134.62,116.84) v1(134.57,53.21) v1(134.62,50.11) v1(134.62,30.48) v1(134.62,27.94) v1(134.62,25.4) v1(134.72,79.63) v1(134.65,70.1) v1(134.65,51.87) v1(134.82,22.68) v1(134.87,57.89) v1(134.98,82.17) v1(134.95,42.32) v1(135.23,122.33) v1(135.15,44.09) v1(135.25,37.46) v1(135.38,49.17) v1(135.59,47.45) v1(135.64,41.53) v1(135.74,102.97) v1(135.71,1.22) v1(135.76,93.19) v1(135.89,120.65) v1(135.94,75.26) v1(136.02,54.97) v1(136.09,73.51) v1(136.3,71.5) v1(136.3,68.4) v1(136.27,60.93) v1(136.27,46.66) v1(136.37,77.47) v1(136.42,70.13) v1(136.35,67.11) v1(136.37,65.35) v1(136.4,64.01) v1(136.4,62.31) v1(136.4,59.23) v1(136.37,44.88) v1(136.42,28.17) v1(136.42,25.63) v1(136.53,87.5) v1(136.47,82.17) v1(136.45,56.16) v1(136.47,53.21) v1(136.53,50.11) v1(136.63,79.63) v1(136.55,51.87) v1(136.78,57.89) v1(136.86,42.32) v1(136.97,10.19) v1(136.97,7.65) v1(136.97,5) v1(136.97,2.46) v1(137.06,44.09) v1(137.16,125.73) v1(137.29,49.17) v1(137.49,47.45) v1(137.54,41.53) v1(137.92,54.97) v1(138,77.47) v1(138.02,75.34) v1(138,73.51) v1(138.18,93.19) v1(138.2,71.5) v1(138.2,68.4) v1(138.18,60.93) v1(138.18,46.66) v1(138.33,70.13) v1(138.25,67.11) v1(138.28,65.35) v1(138.3,64.01) v1(138.3,62.31) v1(138.3,59.23) v1(138.28,44.88) v1(138.25,1.22) v1(138.35,56.16) v1(138.38,53.21) v1(138.43,50.11) v1(138.46,102.97) v1(138.53,79.63) v1(138.46,51.87) v1(138.58,22.29) v1(138.68,57.89) v1(138.76,42.32) v1(138.96,44.09) v1(138.96,28.17) v1(138.96,25.63) v1(139.19,49.17) v1(139.4,47.45) v1(139.5,82.17) v1(139.45,41.53) v1(139.51,10.19) v1(139.51,7.65) v1(139.51,5) v1(139.51,2.46) v1(139.7,125.73) v1(139.7,120.65) v1(139.7,111.76) v1(139.83,54.97) v1(139.9,77.47) v1(139.93,75.34) v1(139.9,73.51) v1(140.11,71.5) v1(140.11,68.4) v1(140.08,60.93) v1(140.08,46.66) v1(140.23,70.13) v1(140.16,67.11) v1(140.18,65.35) v1(140.21,64.01) v1(140.21,62.31) v1(140.21,59.23) v1(140.18,44.88) v1(140.31,102.79) v1(140.26,56.16) v1(140.28,53.21) v1(140.34,50.11) v1(140.44,79.63) v1(140.36,51.87) v1(140.59,57.89) v1(140.72,93.19) v1(140.67,42.32) v1(140.79,1.22) v1(140.87,44.09) v1(141.1,49.17) v1(141.3,47.45) v1(141.35,41.53) v1(141.73,36.83) v1(141.81,77.5) v1(141.83,73.51) v1(141.76,54.97) v1(142.04,71.5) v1(142.01,60.93) v1(141.99,46.66) v1(142.09,67.11) v1(142.11,65.35) v1(142.14,64.01) v1(142.14,62.31) v1(142.14,59.23) v1(142.09,44.88) v1(142.05,10.19) v1(142.05,7.65) v1(142.05,5) v1(142.05,2.46) v1(142.24,125.73) v1(142.19,79.63) v1(142.16,70.13) v1(142.19,56.16) v1(142.21,53.21) v1(142.29,51.87) v1(142.27,50.11) v1(142.37,75.26) v1(142.47,68.4) v1(142.52,57.89) v1(142.6,122.25) v1(142.57,42.32) v1(142.65,82.17) v1(142.77,44.09) v1(143,89.53) v1(143.03,49.17) v1(143.21,47.45) v1(143.26,93.19) v1(143.26,41.53) v1(143.33,1.22) v1(143.38,86.99) v1(143.51,120.65) v1(143.48,103.66) v1(143.71,77.5) v1(143.74,73.51) v1(143.66,54.97) v1(143.76,91.57) v1(143.94,71.5) v1(143.94,68.4) v1(143.89,46.66) v1(143.99,67.11) v1(144.02,65.35) v1(144.04,64.01) v1(144.04,62.31) v1(144.04,59.23) v1(144.04,57.71) v1(143.99,44.88) v1(144.09,79.63) v1(144.07,70.13) v1(144.09,56.16) v1(144.12,53.21) v1(144.2,51.87) v1(144.17,50.11) v1(144.32,82.17) v1(144.25,75.26) v1(144.27,36.83) v1(144.48,42.32) v1(144.63,60.96) v1(144.68,44.09) v1(144.78,125.73) v1(144.78,111.76) v1(144.93,49.17) v1(145.11,47.45) v1(145.06,24.66) v1(145.16,41.53) v1(145.49,77.47) v1(145.64,73.51) v1(145.64,54.91) v1(145.69,103.58) v1(145.8,46.66) v1(145.92,93.19) v1(145.85,71.5) v1(145.85,68.4) v1(145.9,67.11) v1(145.92,65.35) v1(145.9,44.88) v1(145.87,1.22) v1(145.97,75.26) v1(145.97,70.13) v1(145.95,62.31) v1(145.95,59.23) v1(145.95,57.71) v1(146,56.16) v1(146.02,53.21) v1(146.05,64.03) v1(146.1,51.87) v1(146.08,50.11) v1(146.23,60.99) v1(146.38,42.32) v1(146.56,93.22) v1(146.58,44.09) v1(146.84,49.17) v1(146.81,36.83) v1(147.02,47.45) v1(147.07,41.53) v1(147.32,125.73) v1(147.32,120.65) v1(147.4,77.47) v1(147.5,79.55) v1(147.55,104.72) v1(147.55,73.51) v1(147.55,71.45) v1(147.55,54.91) v1(147.7,46.66) v1(147.78,70.1) v1(147.75,68.4) v1(147.8,67.11) v1(147.83,65.35) v1(147.8,44.88) v1(147.85,62.31) v1(147.85,59.23) v1(147.85,57.71) v1(147.9,56.16) v1(147.93,53.21) v1(147.96,64.03) v1(148.01,51.87) v1(147.98,50.11) v1(148.06,75.29) v1(148.13,60.99) v1(148.29,42.32) v1(148.41,1.22) v1(148.46,93.19) v1(148.46,84.45) v1(148.49,44.09) v1(148.74,49.17) v1(148.69,38.7) v1(148.92,47.45) v1(148.97,41.53) v1(149.3,111.51) v1(149.4,79.55) v1(149.45,73.51) v1(149.45,54.91) v1(149.63,122.38) v1(149.61,46.66) v1(149.73,75.29) v1(149.66,71.5) v1(149.68,70.1) v1(149.66,68.4) v1(149.71,67.11) v1(149.76,62.31) v1(149.76,59.23) v1(149.76,57.71) v1(149.81,56.16) v1(149.83,53.21) v1(149.86,125.73) v1(149.86,64.03) v1(149.91,51.87) v1(149.89,50.11) v1(150.04,60.99) v1(150.09,12.9) v1(150.32,36.87) v1(150.49,24.86) v1(150.49,22.32) v1(150.57,65.38) v1(150.65,49.17) v1(150.85,33.83) v1(151,93.19) v1(150.98,70.1) v1(150.95,1.22) v1(151.13,120.65) v1(151.36,73.51) v1(151.36,54.91) v1(151.56,79.6) v1(151.56,71.5) v1(151.56,68.4) v1(151.61,67.11) v1(151.64,65.35) v1(151.66,75.29) v1(151.66,62.31) v1(151.66,59.23) v1(151.66,57.71) v1(151.71,56.16) v1(151.74,53.21) v1(151.77,64.03) v1(151.82,51.87) v1(151.79,50.11) v1(151.94,60.99) v1(152.2,107.44) v1(152.28,35.47) v1(152.4,125.73) v1(152.5,26.77) v1(152.55,49.17) v1(152.68,32.28) v1(152.68,29.74) v1(152.88,70.1) v1(153.03,24.86) v1(153.03,22.32) v1(153.09,111.61) v1(153.29,85.34) v1(153.26,73.51) v1(153.26,54.91) v1(153.26,41.53) v1(153.37,46.61) v1(153.39,31.29) v1(153.54,93.19) v1(153.47,79.6) v1(153.52,75.26) v1(153.47,71.5) v1(153.52,67.11) v1(153.54,65.35) v1(153.49,1.22) v1(153.57,62.31) v1(153.57,59.23) v1(153.57,57.71) v1(153.62,56.16) v1(153.64,53.21) v1(153.63,4.39) v1(153.67,64.03) v1(153.72,51.87) v1(153.7,50.11) v1(153.67,36.83) v1(153.85,60.99) v1(154.03,68.4) v1(154.33,94.95) v1(154.31,42.32) v1(154.31,38.73) v1(154.41,47.4) v1(154.4,33.11) v1(154.46,49.17) v1(154.79,70.1) v1(154.79,46.61) v1(154.84,41.53) v1(154.94,125.73) v1(154.94,35.56) v1(155.03,4.41) v1(155.09,105.92) v1(155.17,73.51) v1(155.17,54.91) v1(155.32,103.3) v1(155.42,75.31) v1(155.37,71.5) v1(155.37,68.4) v1(155.42,67.11) v1(155.44,28.16) v1(155.45,120.19) v1(155.45,65.35) v1(155.47,62.31) v1(155.47,59.23) v1(155.47,57.71) v1(155.52,56.16) v1(155.58,84.33) v1(155.58,64.03) v1(155.55,53.21) v1(155.63,51.87) v1(155.6,50.11) v1(155.57,24.86) v1(155.57,22.32) v1(155.67,20.02) v1(155.75,60.99) v1(155.83,47.4) v1(155.93,87.55) v1(155.88,42.32) v1(156.03,1.22) v1(156.08,93.19) v1(156.21,36.83) v1(156.15,4.73) v1(156.36,49.17) v1(156.44,41.53) v1(156.51,46.61) v1(156.69,70.1) v1(156.75,30.56) v1(156.84,122.38) v1(156.84,38.73) v1(156.97,8.43) v1(157.07,73.51) v1(157.07,54.91) v1(157.28,71.5) v1(157.28,68.4) v1(157.3,67.11) v1(157.4,109.86) v1(157.4,107.21) v1(157.35,65.35) v1(157.38,62.31) v1(157.38,59.23) v1(157.38,57.71) v1(157.43,56.16) v1(157.43,13.39) v1(157.48,125.73) v1(157.48,64.03) v1(157.45,53.21) v1(157.53,51.87) v1(157.51,50.11) v1(157.48,42.32) v1(157.48,35.56) v1(157.48,33.02) v1(157.51,10.87) v1(157.56,47.4) v1(157.73,84.58) v1(157.71,75.29) v1(157.66,60.99) v1(157.96,20.75) v1(157.96,18.21) v1(157.99,16.87) v1(158.22,41.53) v1(158.27,49.17) v1(158.26,6.24) v1(158.42,46.61) v1(158.5,79.91) v1(158.62,93.19) v1(158.6,70.1) v1(158.57,1.22) v1(158.75,90.04) v1(158.78,82.45) v1(158.75,36.83) v1(158.98,73.51) v1(158.98,54.91) v1(159.05,51.87) v1(159.18,71.5) v1(159.18,68.4) v1(159.21,67.11) v1(159.26,65.35) v1(159.28,62.31) v1(159.28,59.23) v1(159.28,57.71) v1(159.33,56.16) v1(159.26,42.32) v1(159.38,64.03) v1(159.36,53.21) v1(159.41,50.11) v1(159.38,38.73) v1(159.46,75.21) v1(159.46,47.4) v1(159.56,60.99) v1(159.77,44.07) v1(159.82,16.94) v1(159.94,107.21) v1(160.02,125.73) v1(160.02,35.56) v1(160.02,33.02) v1(160.02,30.48) v1(160.02,27.94) v1(160.02,25.4) v1(160.02,22.86) v1(160.02,20.32) v1(160.07,41.53) v1(160.17,49.17) v1(160.17,46.61) v1(160.32,79.93) v1(160.5,70.1) v1(160.81,44.86) v1(160.88,73.51) v1(160.88,54.91) v1(161.04,93.19) v1(161.09,71.5) v1(161.09,68.4) v1(161.11,67.11) v1(161.11,42.32) v1(161.16,65.35) v1(161.19,62.31) v1(161.19,59.23) v1(161.19,57.71) v1(161.24,56.16) v1(161.21,47.4) v1(161.29,64.03) v1(161.26,53.21) v1(161.34,51.87) v1(161.32,50.11) v1(161.26,44.09) v1(161.29,36.83) v1(161.47,60.99) v1(161.93,46.61) v1(161.93,38.73) v1(162.08,49.17) v1(162.18,90.04) v1(162.26,79.93) v1(162.31,44.88) v1(162.43,71.5) v1(162.41,70.1) v1(162.56,125.73) v1(162.56,123.19) v1(162.59,75.13) v1(162.56,35.56) v1(162.56,33.02) v1(162.56,27.94) v1(162.56,25.4) v1(162.56,22.86) v1(162.81,82.45) v1(162.79,54.91) v1(162.99,68.4) v1(163.02,67.11) v1(162.97,47.4) v1(162.99,39.75) v1(163.07,65.35) v1(163.09,62.31) v1(163.09,59.23) v1(163.09,57.71) v1(163.14,56.16) v1(163.19,64.03) v1(163.17,53.21) v1(163.22,50.11) v1(163.25,51.87) v1(163.4,73.2) v1(163.37,60.99) v1(163.53,44.07) v1(163.58,93.19) v1(163.73,70.13) v1(163.78,46.61) v1(163.83,36.83) v1(163.98,49.17) v1(164.13,79.96) v1(164.26,73.2) v1(164.26,41.53) v1(164.47,38.73) v1(164.57,44.86) v1(164.69,54.91) v1(164.82,47.4) v1(164.9,68.4) v1(164.92,67.11) v1(164.9,39.75) v1(164.97,65.35) v1(165,62.31) v1(165,59.23) v1(165,57.71) v1(165.1,125.73) v1(165.1,123.19) v1(165.1,64.03) v1(165.05,56.16) v1(165.07,53.21) v1(165.13,50.11) v1(165.05,44.07) v1(165.1,25.4) v1(165.1,20.32) v1(165.15,71.45) v1(165.15,51.87) v1(165.28,60.99) v1(165.3,42.32) v1(165.66,46.66) v1(165.73,1.14) v1(165.86,79.93) v1(165.89,49.17) v1(166.01,71.48) v1(166.09,44.86) v1(166.24,93.19) v1(166.22,75.29) v1(166.17,41.53) v1(166.42,82.45) v1(166.42,70.66) v1(166.6,54.91) v1(166.7,47.45) v1(166.83,67.11) v1(166.8,39.75) v1(166.88,65.35) v1(166.9,62.31) v1(166.9,59.23) v1(166.9,57.71) v1(166.85,44.07) v1(167,64.03) v1(166.95,56.16) v1(166.98,53.21) v1(167.03,50.11) v1(167.06,51.87) v1(167.18,60.99) v1(167.21,42.32) v1(167.44,68.35) v1(167.46,109.04) v1(167.51,73.2) v1(167.64,125.73) v1(167.64,123.19) v1(167.64,20.32) v1(167.69,74.3) v1(167.67,46.63) v1(167.79,79.93) v1(167.79,49.17) v1(167.89,44.86) v1(168,75.31) v1(168.07,41.53) v1(168.33,70.66) v1(168.27,1.14) v1(168.5,54.91) v1(168.55,65.41) v1(168.71,73.18) v1(168.71,68.4) v1(168.73,67.11) v1(168.71,47.42) v1(168.71,39.75) v1(168.78,93.19) v1(168.81,62.31) v1(168.81,59.23) v1(168.81,57.71) v1(168.76,44.07) v1(168.91,64.03) v1(168.86,56.16) v1(168.88,53.21) v1(168.94,50.11) v1(168.96,51.87) v1(169.09,60.99) v1(169.11,42.32) v1(169.39,75.29) v1(169.42,46.61) v1(169.62,79.96) v1(169.6,74.3) v1(169.7,49.17) v1(169.8,44.86) v1(169.98,41.53) v1(170.05,95.12) v1(170.18,125.73) v1(170.18,123.19) v1(170.18,82.47) v1(170.18,37.46) v1(170.18,20.32) v1(170.41,54.91) v1(170.46,65.41) v1(170.46,47.4) v1(170.59,108.1) v1(170.61,73.18) v1(170.61,68.4) v1(170.64,67.11) v1(170.61,39.75) v1(170.71,62.31) v1(170.71,59.23) v1(170.71,57.71) v1(170.66,44.07) v1(170.79,75.29) v1(170.81,64.03) v1(170.76,56.16) v1(170.79,53.21) v1(170.84,50.11) v1(170.87,51.87) v1(170.99,60.99) v1(171.02,42.32) v1(170.96,1.18) v1(171.17,116.81) v1(171.2,88.9) v1(171.32,46.61) v1(171.5,74.3) v1(171.6,49.17) v1(171.7,96.52) v1(171.7,44.86) v1(171.88,41.53) v1(172.09,77.39) v1(172.31,54.91) v1(172.36,65.41) v1(172.36,57.89) v1(172.36,47.4) v1(172.52,73.18) v1(172.54,70.66) v1(172.52,68.4) v1(172.54,67.11) v1(172.52,39.75) v1(172.62,105.31) v1(172.64,75.29) v1(172.62,62.31) v1(172.62,59.23) v1(172.57,44.07) v1(172.72,125.73) v1(172.72,123.19) v1(172.72,64.03) v1(172.67,56.16) v1(172.69,53.21) v1(172.72,37.46) v1(172.72,35.56) v1(172.72,27.94) v1(172.72,25.4) v1(172.72,22.86) v1(172.72,20.32) v1(172.77,51.87) v1(172.75,50.11) v1(172.9,60.99) v1(172.92,42.32) v1(173.05,94.59) v1(173.23,46.61) v1(173.41,74.3) v1(173.46,79.93) v1(173.51,49.17) v1(173.5,1.18) v1(173.61,44.86) v1(173.79,41.53) v1(173.92,103.78) v1(173.92,102.92) v1(173.92,102.06) v1(173.92,101.2) v1(173.99,116.84) v1(173.99,114.3) v1(174.04,110.77) v1(174.04,109.91) v1(174.04,109.04) v1(174.04,108.18) v1(174.02,82.45) v1(174.24,77.34) v1(174.22,54.91) v1(174.27,65.41) v1(174.27,57.89) v1(174.27,47.4) v1(174.42,73.18) v1(174.42,68.4) v1(174.42,39.75) v1(174.47,85.8) v1(174.45,70.66) v1(174.45,67.11) v1(174.52,62.31) v1(174.52,59.23) v1(174.47,44.07) v1(174.62,64.03) v1(174.57,56.16) v1(174.6,53.21) v1(174.68,51.87) v1(174.65,50.11) v1(174.78,103.78) v1(174.78,102.92) v1(174.78,102.06) v1(174.78,101.2) v1(174.8,60.99) v1(174.83,42.32) v1(174.9,110.77) v1(174.9,109.91) v1(174.9,109.04) v1(174.9,108.18) v1(174.93,93.7) v1(175.01,89.18) v1(175.13,46.61) v1(175.26,125.73) v1(175.26,123.19) v1(175.26,106.25) v1(175.26,79.96) v1(175.26,37.46) v1(175.26,35.56) v1(175.26,33.02) v1(175.26,25.4) v1(175.26,22.86) v1(175.26,20.32) v1(175.26,18.82) v1(175.41,49.17) v1(175.51,44.86) v1(175.64,102.92) v1(175.64,102.06) v1(175.64,101.2) v1(175.69,41.53) v1(175.77,109.91) v1(175.77,109.04) v1(175.77,108.18) v1(176.04,1.18) v1(176.12,54.91) v1(176.17,65.41) v1(176.17,57.89) v1(176.17,47.4) v1(176.33,68.4) v1(176.33,39.75) v1(176.4,105.21) v1(176.35,70.66) v1(176.35,67.11) v1(176.43,62.31) v1(176.43,59.23) v1(176.38,44.07) v1(176.53,116.84) v1(176.53,114.3) v1(176.53,64.03) v1(176.48,56.16) v1(176.5,53.21) v1(176.58,51.87) v1(176.56,50.11) v1(176.71,60.99) v1(176.73,42.32) v1(176.81,77.34) v1(177.04,46.61) v1(177.11,87.38) v1(177.32,79.96) v1(177.32,49.17) v1(177.42,44.86) v1(177.6,41.53) v1(177.8,125.73) v1(177.8,123.19) v1(177.8,22.86) v1(177.8,20.32) v1(177.8,18.82) v1(177.88,82.47) v1(177.98,95.55) v1(178.03,54.91) v1(178.08,65.41) v1(178.08,57.89) v1(178.08,47.4) v1(178.23,68.4) v1(178.23,39.75) v1(178.26,70.66) v1(178.26,67.11) v1(178.33,62.31) v1(178.33,59.23) v1(178.28,44.07) v1(178.36,113.13) v1(178.44,64.03) v1(178.38,56.16) v1(178.41,53.21) v1(178.49,51.87) v1(178.46,50.11) v1(178.61,60.99) v1(178.64,42.32) v1(178.58,1.18) v1(178.69,115.93) v1(178.79,75.29) v1(178.92,80.01) v1(178.94,46.61) v1(179.22,49.17) v1(179.3,77.32) v1(179.32,44.86) v1(179.53,95.94) v1(179.5,41.53) v1(179.63,8.11) v1(179.63,5.57) v1(179.86,73.2) v1(179.93,54.91) v1(179.98,65.41) v1(179.98,57.89) v1(179.98,47.4) v1(180.14,102.77) v1(180.14,68.4) v1(180.14,39.75) v1(180.16,67.11) v1(180.24,62.31) v1(180.24,59.23) v1(180.19,44.07) v1(180.34,125.73) v1(180.34,123.19) v1(180.34,64.03) v1(180.29,56.16) v1(180.31,53.21) v1(180.34,22.86) v1(180.34,20.32) v1(180.34,18.82) v1(180.37,88.47) v1(180.42,79.96) v1(180.39,51.87) v1(180.37,50.11) v1(180.47,86.66) v1(180.52,60.99) v1(180.54,42.32) v1(180.57,74.35) v1(180.85,46.61) v1(180.98,82.47) v1(180.98,37.46) v1(181.11,111.78) v1(181.11,110.92) v1(181.13,49.17) v1(181.12,1.18) v1(181.16,106.95) v1(181.23,44.86) v1(181.33,75.31) v1(181.33,73.18) v1(181.36,70.51) v1(181.41,41.53) v1(181.64,65.38) v1(181.79,119.58) v1(181.79,118.72) v1(181.79,117.86) v1(181.79,116.99) v1(181.84,54.91) v1(181.86,91.19) v1(181.89,57.89) v1(181.89,47.4) v1(182.04,71.5) v1(182.04,68.4) v1(182.04,39.75) v1(182.07,67.11) v1(182.14,62.31) v1(182.14,59.23) v1(182.09,44.07) v1(182.25,77.37) v1(182.25,64.03) v1(182.19,56.16) v1(182.22,53.21) v1(182.17,8.11) v1(182.17,5.57) v1(182.25,111.78) v1(182.25,110.94) v1(182.27,79.98) v1(182.3,51.87) v1(182.27,50.11) v1(182.42,60.99) v1(182.5,74.42) v1(182.45,42.32) v1(182.65,119.58) v1(182.65,118.72) v1(182.65,117.86) v1(182.65,116.99) v1(182.68,103.91) v1(182.8,94.51) v1(182.75,46.61) v1(182.88,125.73) v1(182.88,123.19) v1(182.93,97.05) v1(182.85,70.56) v1(182.88,27.94) v1(182.88,22.86) v1(182.88,20.32) v1(182.88,18.82) v1(183.03,49.17) v1(183.13,44.86) v1(183.31,41.53) v1(183.39,111.78) v1(183.42,110.92) v1(183.36,75.31) v1(183.51,118.72) v1(183.51,117.86) v1(183.51,116.99) v1(183.54,65.38) v1(183.52,37.46) v1(183.74,73.18) v1(183.74,54.91) v1(183.79,57.89) v1(183.79,47.4) v1(183.87,71.55) v1(183.92,63.98) v1(183.97,79.96) v1(183.95,68.4) v1(184,44.07) v1(183.95,39.75) v1(184.05,62.31) v1(184.05,59.23) v1(184.1,56.16) v1(184.12,53.21) v1(184.15,105.41) v1(184.15,92.71) v1(184.2,51.87) v1(184.18,50.11) v1(184.33,60.99) v1(184.35,42.32) v1(184.54,111.78) v1(184.53,82.47) v1(184.56,115.54) v1(184.56,110.92) v1(184.66,46.61) v1(184.84,100.36) v1(184.86,74.24) v1(184.94,49.17) v1(185.04,44.86) v1(185.19,66.83) v1(185.22,41.53) v1(185.34,65.53) v1(185.32,57.89) v1(185.42,125.73) v1(185.42,123.19) v1(185.42,110.49) v1(185.42,91.44) v1(185.42,35.56) v1(185.42,33.02) v1(185.42,30.48) v1(185.42,27.94) v1(185.42,25.4) v1(185.42,22.86) v1(185.42,20.32) v1(185.45,97.89) v1(185.5,77.37) v1(185.5,73.23) v1(185.57,108.31) v1(185.55,107.37) v1(185.65,54.91) v1(185.7,47.4) v1(185.93,120.68) v1(185.93,75.31) v1(185.88,70.54) v1(185.9,44.07) v1(185.85,39.75) v1(186,126.44) v1(185.95,124.89) v1(185.98,123.47) v1(185.98,122.22) v1(185.95,119.25) v1(185.95,62.31) v1(185.95,59.23) v1(186.08,110.49) v1(186.11,51.87) v1(186.08,50.11) v1(186.06,37.46) v1(186.18,80.01) v1(186.23,71.5) v1(186.16,63.75) v1(186.31,111.76) v1(186.33,108.31) v1(186.31,107.37) v1(186.26,42.32) v1(186.53,95.23) v1(186.51,94.13) v1(186.64,68.3) v1(186.56,46.61) v1(186.74,124.13) v1(186.74,121.49) v1(186.72,119.91) v1(186.72,104.01) v1(186.69,92.71) v1(186.77,125.7) v1(186.77,66.83) v1(186.84,49.17) v1(186.94,44.86) v1(186.97,60.96) v1(187.12,41.53) v1(187.25,106.1) v1(187.25,105.18) v1(187.43,119.28) v1(187.5,126.42) v1(187.48,124.92) v1(187.45,123.49) v1(187.48,122.2) v1(187.45,120.7) v1(187.5,82.45) v1(187.45,71.58) v1(187.5,63.91) v1(187.6,47.4) v1(187.66,75.31) v1(187.76,57.91) v1(187.81,44.07) v1(187.93,65.53) v1(187.96,118.11) v1(188.01,106.1) v1(187.96,87.63) v1(187.96,77.37) v1(187.96,73.18) v1(187.99,50.11) v1(187.96,25.4) v1(188.11,79.98) v1(188.21,68.3) v1(188.16,42.32) v1(188.26,39.75) v1(188.39,60.93) v1(188.47,46.61) v1(188.8,70.51) v1(188.8,57.89) v1(188.75,49.17) v1(188.85,44.86) v1(189.13,73.2) v1(189.23,125.73) v1(189.15,108.36) v1(189.23,66.85) v1(189.15,65.53) v1(189.51,47.4) v1(189.53,41.53) v1(189.53,20.17) v1(189.71,77.39) v1(189.66,71.5) v1(189.71,44.07) v1(189.79,103.94) v1(189.76,63.83) v1(190.04,119.86) v1(190.07,121.67) v1(190.07,75.31) v1(190.42,79.91) v1(190.4,66.83) v1(190.37,46.61) v1(190.5,118.11) v1(190.5,115.57) v1(190.5,97.79) v1(190.45,70.54) v1(190.58,82.45) v1(190.58,42.32) v1(190.68,68.25) v1(190.7,56.16) v1(190.75,44.86) v1(191.21,75.34) v1(191.34,63.88) v1(191.34,31.67) v1(191.6,90.41) v1(191.57,73.18) v1(191.57,71.5) v1(191.77,125.73) v1(191.77,87.63) v1(191.82,51.87) v1(191.87,68.33) v1(191.97,114.38) v1(192.03,89.73) v1(191.95,54.91) v1(192.1,77.37) v1(192.13,44.07) v1(192.33,79.98) v1(192.41,110.97) v1(192.46,90.39) v1(192.48,39.75) v1(192.58,59.21) v1(192.68,74.35) v1(192.81,70.48) v1(192.84,66.83) v1(192.86,82.27) v1(192.96,102.03) v1(193.04,33.02) v1(193.04,25.4) v1(193.14,73.2) v1(193.17,98.65) v1(193.19,62.28) v1(193.17,44.86) v1(193.29,77.39) v1(193.32,47.4) v1(193.5,90.72) v1(193.65,75.34) v1(193.65,53.21) v1(193.7,50.11) v1(193.8,59.21) v1(193.95,82.35) v1(193.95,71.53) v1(194.13,70.54) v1(194.31,125.73) v1(194.28,74.35) v1(194.28,68.25) v1(194.26,66.83) v1(194.31,60.96) v1(194.26,41.53) v1(194.42,90.72) v1(194.42,23.98) v1(194.42,22.71) v1(194.46,49.17) v1(194.61,79.91) v1(194.69,46.61) v1(194.69,39.78) v1(194.77,114.38) v1(194.97,111) v1(194.97,57.91) v1(195.22,75.34) v1(195.3,42.32) v1(195.38,96.15) v1(195.36,95.29) v1(195.38,71.5) v1(195.4,65.53) v1(195.53,56.16) v1(195.45,54.94) v1(195.58,87.63) v1(195.58,73.18) v1(195.63,62.28) v1(195.58,60.96) v1(195.63,51.87) v1(195.58,25.4) v1(195.73,77.37) v1(195.67,23.98) v1(195.67,22.71) v1(195.83,126.42) v1(195.78,124.87) v1(195.81,123.44) v1(195.83,122.22) v1(195.78,120.68) v1(195.81,119.25) v1(195.81,90.79) v1(195.76,41.5) v1(196.01,79.96) v1(196.04,31.65) v1(196.14,95.72) v1(196.44,106.71) v1(196.44,82.37) v1(196.47,105.92) v1(196.6,125.68) v1(196.57,124.1) v1(196.6,121.49) v1(196.57,119.91) v1(196.65,115.72) v1(196.67,74.27) v1(196.77,73.18) v1(196.77,65.53) v1(196.85,118.11) v1(196.93,96.15) v1(196.93,95.29) v1(197.03,90.44) v1(197,39.78) v1(197.15,70.48) v1(197.33,126.39) v1(197.31,124.89) v1(197.28,123.47) v1(197.33,122.2) v1(197.31,120.7) v1(197.28,119.28) v1(197.28,71.5) v1(197.44,91.1) v1(197.38,63.83) v1(197.36,54.94) v1(197.41,44.07) v1(197.46,53.21) v1(197.51,50.11) v1(197.56,106.71) v1(197.56,105.92) v1(197.74,75.34) v1(197.79,90.44) v1(197.89,74.35) v1(197.94,68.02) v1(198.12,35.56) v1(198.12,33.02) v1(198.15,59.21) v1(198.42,82.37) v1(198.58,64.03) v1(198.65,79.81) v1(198.73,28.91) v1(198.73,27) v1(198.73,25.1) v1(198.73,23.19) v1(198.73,21.29) v1(198.73,19.38) v1(198.73,17.48) v1(198.73,15.57) v1(198.73,13.67) v1(198.73,11.76) v1(198.73,9.86) v1(198.73,7.95) v1(198.73,6.05) v1(198.73,4.14) v1(198.73,2.24) v1(198.76,125.7) v1(198.76,123.8) v1(198.76,121.89) v1(198.76,119.99) v1(198.76,118.08) v1(198.76,116.18) v1(198.76,114.27) v1(198.76,112.37) v1(198.76,110.46) v1(198.76,108.56) v1(198.76,106.65) v1(198.76,104.75) v1(198.76,102.84) v1(198.78,57.91) v1(198.78,51.66) v1(198.96,53.14) v1(198.98,39.78) v1(199.24,75.36) v1(199.34,77.34) v1(199.29,68.4) v1(199.29,62.26) v1(199.39,91.44) v1(199.69,60.99) v1(199.77,50.01) v1(199.82,29.79) v1(199.95,65.33) v1(200.23,42.29) v1(200.25,51.66) v1(200.43,97.82) v1(200.48,67.08) v1(200.51,52.5) v1(200.56,49.1) v1(200.63,47.5) v1(200.91,63.91) v1(201.09,82.27) v1(201.19,31.57) v1(201.3,66.7) v1(201.3,39.78) v1(201.47,75.31) v1(201.52,74.52) v1(201.47,60.99) v1(201.73,50.04) v1(201.73,29.79) v1(201.88,41.5) v1(201.96,44.04) v1(202.34,97.82) v1(202.34,65.28) v1(202.44,42.29) v1(202.51,44.83) v1(202.56,52.48) v1(202.9,46.46) v1(203.2,96.52) v1(203.2,35.56) v1(203.2,33.02) v1(203.63,29.79) v1(204.24,97.82) v1(205.11,84.45) v1(205.11,83.19) v1(205.54,29.79) v1(206.15,97.82) v1(206.38,81.91) v1(207.65,83.19) v1(208.05,97.82) v1(208.28,35.56) v1(208.92,81.91) v1(209.35,29.79) v1(209.96,97.82) v1(210.19,84.45) v1(210.19,83.19) v1(210.82,96.52) v1(210.82,93.98) v1(210.82,35.56) v1(210.82,33.02) v1(211.25,29.79) v1(211.86,97.82) v1(213.16,29.79) v1(213.36,96.52) v1(213.36,93.98) v1(213.36,35.56) v1(213.36,33.02) v1(213.77,97.82) v1(215.06,29.79) v1(215.34,89.81) v1(215.67,97.82) v1(215.9,96.52) v1(215.9,93.98) v1(215.9,35.56) v1(216.97,29.79) v1(217.58,97.82) v1(218.54,97.28) v1(218.54,95.38) v1(218.54,93.47) v1(218.54,91.57) v1(218.54,89.66) v1(218.54,87.76) v1(218.54,85.85) v1(218.54,83.95) v1(218.54,82.04) v1(218.54,80.14) v1(218.54,78.23) v1(218.54,76.33) v1(218.54,74.42) v1(218.54,72.52) v1(218.54,70.61) v1(218.54,68.71) v1(218.54,66.8) v1(218.54,64.9) v1(218.54,62.99) v1(218.54,61.09) v1(218.54,59.18) v1(218.54,57.28) v1(218.54,55.37) v1(218.54,53.47) v1(218.54,51.56) v1(218.54,49.66) v1(218.54,47.75) v1(218.54,45.85) v1(218.54,43.94) v1(218.54,42.04) v1(218.54,40.13) v1(218.54,38.23) v1(218.54,36.32) v1(218.54,34.42) v1(218.54,32.51) v1(218.54,30.61) v2(0.53,74.68) v2(0.53,73.79) v2(0.53,72.9) v2(0.53,67.56) v2(0.53,66.67) v2(0.53,65.79) v2(0.56,60.35) v2(0.56,59.46) v2(0.56,58.57) v2(0.56,53.24) v2(0.56,52.35) v2(0.56,51.46) v2(1.3,74.68) v2(1.3,73.79) v2(1.3,72.9) v2(1.3,67.56) v2(1.3,66.67) v2(1.3,65.79) v2(1.32,60.35) v2(1.32,59.46) v2(1.32,58.57) v2(1.32,53.24) v2(1.32,52.35) v2(1.32,51.46) v2(1.67,82.26) v2(1.73,44.49) v2(2.12,83.03) v2(2.06,74.68) v2(2.06,73.79) v2(2.06,72.9) v2(2.06,67.56) v2(2.06,66.67) v2(2.06,65.79) v2(2.08,60.35) v2(2.08,59.46) v2(2.08,58.57) v2(2.08,53.24) v2(2.08,52.35) v2(2.08,51.46) v2(2.18,43.72) v2(2.33,81.88) v2(2.39,44.87) v2(2.56,83.8) v2(2.62,42.95) v2(2.78,82.65) v2(2.82,74.68) v2(2.82,73.79) v2(2.82,72.9) v2(2.82,67.56) v2(2.82,66.67) v2(2.82,65.79) v2(2.84,60.35) v2(2.84,59.46) v2(2.84,58.57) v2(2.84,53.24) v2(2.84,52.35) v2(2.84,51.46) v2(2.84,44.1) v2(2.99,81.5) v2(3.05,45.25) v2(3.22,83.42) v2(3.28,43.33) v2(3.44,82.27) v2(3.5,44.48) v2(3.58,74.68) v2(3.58,73.79) v2(3.58,72.9) v2(3.58,67.56) v2(3.58,66.67) v2(3.58,65.79) v2(3.61,60.35) v2(3.61,59.46) v2(3.61,58.57) v2(3.61,53.24) v2(3.61,52.35) v2(3.61,51.46) v2(3.65,81.12) v2(3.71,45.63) v2(3.88,83.04) v2(3.94,43.71) v2(4.1,81.89) v2(4.16,44.86) v2(4.31,80.74) v2(4.37,46.01) v2(4.54,82.66) v2(4.6,44.09) v2(4.76,81.51) v2(4.82,45.24) v2(5.23,88.42) v2(5.2,82.28) v2(5.26,44.47) v2(5.29,38.33) v2(5.67,89.19) v2(5.73,37.56) v2(5.89,88.04) v2(5.95,38.71) v2(6.12,89.96) v2(6.18,36.79) v2(6.33,88.81) v2(6.39,37.94) v2(6.55,87.66) v2(6.61,39.09) v2(6.78,89.58) v2(6.84,37.17) v2(6.99,88.43) v2(7.05,38.32) v2(7.21,87.28) v2(7.27,39.47) v2(7.44,89.2) v2(7.5,37.55) v2(7.65,88.05) v2(7.71,38.7) v2(7.87,86.9) v2(7.93,39.85) v2(8.1,88.82) v2(8.16,37.93) v2(8.31,87.67) v2(8.37,39.08) v2(8.76,88.44) v2(8.82,38.31) v2(11.32,28.01) v2(11.6,99.4) v2(11.77,27.24) v2(11.98,28.39) v2(12.05,100.17) v2(12.21,26.47) v2(12.26,99.02) v2(12.43,27.62) v2(12.49,100.94) v2(12.64,28.77) v2(12.71,99.79) v2(12.92,98.64) v2(12.87,26.85) v2(13.09,28) v2(13.15,100.56) v2(13.3,29.15) v2(13.37,99.41) v2(13.53,27.23) v2(13.58,98.26) v2(13.81,100.18) v2(13.75,28.38) v2(14.03,99.03) v2(13.96,29.53) v2(14.24,97.88) v2(14.19,27.61) v2(14.41,28.76) v2(14.47,99.8) v2(14.69,98.65) v2(14.85,27.99) v2(14.88,21.85) v2(15.13,99.42) v2(15.16,105.56) v2(15.32,21.08) v2(15.54,22.23) v2(15.6,106.33) v2(15.82,105.18) v2(15.77,20.31) v2(15.98,21.46) v2(16.05,107.1) v2(16.2,22.61) v2(16.26,105.95) v2(16.43,20.69) v2(16.48,104.8) v2(16.64,21.84) v2(16.71,106.72) v2(16.92,105.57) v2(16.86,22.99) v2(17.14,104.42) v2(17.09,21.07) v2(17.3,22.22) v2(17.37,106.34) v2(17.52,23.37) v2(17.58,105.19) v2(17.8,104.04) v2(17.75,21.45) v2(18.03,105.96) v2(17.96,22.6) v2(18.24,104.81) v2(18.41,21.83) v2(18.69,105.58) v2(23.15,14.12) v2(23.53,14.78) v2(23.91,15.44) v2(23.92,13.67) v2(23.96,113.42) v2(24.34,112.76) v2(24.29,16.1) v2(24.3,14.33) v2(24.73,113.86) v2(24.73,112.1) v2(24.7,74.43) v2(24.74,65.61) v2(24.73,54.8) v2(24.71,52.7) v2(24.67,16.76) v2(24.68,14.99) v2(24.69,13.23) v2(24.79,69.96) v2(24.77,68.73) v2(24.84,61.49) v2(24.77,56.29) v2(25.11,113.2) v2(25.11,111.44) v2(25.06,15.65) v2(25.07,13.89) v2(25.44,16.31) v2(25.5,114.3) v2(25.5,112.54) v2(25.49,110.78) v2(25.45,14.55) v2(25.83,15.21) v2(25.88,113.64) v2(25.88,111.88) v2(26.04,74.37) v2(26.21,15.87) v2(26.27,112.98) v2(26.26,111.22) v2(26.65,112.32) v2(26.87,61.57) v2(27.03,111.67) v2(27.36,47.18) v2(27.6,79.97) v2(27.58,74.29) v2(28.06,81.29) v2(28.2,52.75) v2(28.61,82.3) v2(29.1,83.18) v2(29.29,48.54) v2(29.31,10.56) v2(29.4,65.42) v2(29.69,11.22) v2(30.12,116.97) v2(30.07,11.88) v2(30.08,10.12) v2(30.18,78.49) v2(30.25,42.1) v2(30.5,116.31) v2(30.45,12.54) v2(30.46,10.78) v2(30.79,74.37) v2(30.77,61.65) v2(30.83,13.2) v2(30.84,11.44) v2(30.89,117.42) v2(30.88,115.65) v2(30.85,9.67) v2(31.05,40.87) v2(31.24,86.74) v2(31.22,12.1) v2(31.23,10.33) v2(31.27,116.76) v2(31.27,114.99) v2(31.6,12.76) v2(31.61,10.99) v2(31.66,117.86) v2(31.65,116.1) v2(31.65,114.33) v2(31.8,77.56) v2(31.75,39.55) v2(32.04,117.2) v2(32.04,115.44) v2(31.99,11.65) v2(32.07,87.7) v2(32.42,116.54) v2(32.42,114.78) v2(32.43,74.35) v2(32.37,12.31) v2(32.64,50.39) v2(32.81,115.88) v2(32.87,76.86) v2(33.19,115.22) v2(33.34,86.92) v2(33.67,74.31) v2(33.71,73.15) v2(33.67,68.81) v2(33.68,59.59) v2(33.71,50.93) v2(33.78,58.57) v2(33.85,56.02) v2(34.35,86.32) v2(35.02,51.69) v2(35.72,6.88) v2(35.87,76.92) v2(36.1,7.54) v2(36.54,120.65) v2(36.46,78.03) v2(36.46,49.29) v2(36.49,8.2) v2(36.49,6.43) v2(36.92,119.99) v2(36.87,8.86) v2(36.87,7.09) v2(37.23,84.69) v2(37.31,121.1) v2(37.3,119.33) v2(37.25,9.52) v2(37.26,7.75) v2(37.26,5.99) v2(37.64,8.41) v2(37.64,6.65) v2(37.69,120.44) v2(37.68,118.67) v2(37.65,97.73) v2(37.92,46.84) v2(38.02,9.07) v2(38.03,7.31) v2(38.08,121.54) v2(38.07,119.78) v2(38.06,118.02) v2(38.05,29.03) v2(38.15,80.97) v2(38.29,95.53) v2(38.33,30.18) v2(38.41,7.97) v2(38.46,120.88) v2(38.45,119.12) v2(38.65,83.88) v2(38.84,120.22) v2(38.83,118.46) v2(38.79,8.63) v2(38.87,82.24) v2(39.11,98.17) v2(39.09,92.36) v2(39.22,119.56) v2(39.24,33.76) v2(39.51,90.76) v2(39.6,118.9) v2(39.64,35.37) v2(39.75,83.23) v2(40.08,36.86) v2(40.42,87.44) v2(40.51,98.53) v2(40.72,39.33) v2(41.06,85.18) v2(41.35,83.93) v2(41.49,42.18) v2(41.79,43.13) v2(41.88,3.32) v2(42.26,3.98) v2(42.64,4.64) v2(42.7,124.21) v2(42.65,2.88) v2(42.89,84.29) v2(42.88,42.85) v2(42.85,27.74) v2(43.03,5.3) v2(43.03,3.54) v2(43.08,123.55) v2(43.41,5.96) v2(43.41,4.2) v2(43.42,2.43) v2(43.47,124.66) v2(43.46,122.89) v2(43.84,122.23) v2(43.8,4.86) v2(43.8,3.09) v2(43.85,124) v2(44.24,125.1) v2(44.23,123.34) v2(44.22,121.57) v2(44.18,5.52) v2(44.18,3.75) v2(44.38,99.59) v2(44.62,124.44) v2(44.61,122.68) v2(44.57,4.41) v2(45,123.78) v2(44.99,122.02) v2(44.95,5.07) v2(45.38,123.12) v2(45.76,122.46) v2(45.88,100.05) v2(47.62,85.5) v2(47.8,41.5) v2(48.65,85.78) v2(48.93,26.09) v2(49.45,100.97) v2(50.53,101.18) v2(50.91,100.01) v2(50.85,25.55) v2(51.49,27.81) v2(51.73,96.85) v2(52.2,95.17) v2(52.38,31.18) v2(52.71,93.34) v2(52.66,86.75) v2(52.73,32.61) v2(52.86,40.18) v2(53.16,91.57) v2(53.77,36.36) v2(53.97,88.37) v2(54.17,38.09) v2(54.74,39.62) v2(55.4,3.58) v2(55.4,2.82) v2(55.4,2.06) v2(55.4,1.3) v2(55.4,0.53) v2(56.31,39.88) v2(56.29,3.58) v2(56.29,2.82) v2(56.29,2.06) v2(56.29,1.3) v2(56.29,0.53) v2(56.39,126.47) v2(56.39,125.7) v2(56.39,124.94) v2(56.39,124.18) v2(56.39,123.42) v2(56.4,88.47) v2(57,91.14) v2(57.18,3.58) v2(57.18,2.82) v2(57.18,2.06) v2(57.18,1.3) v2(57.18,0.53) v2(57.28,126.47) v2(57.28,125.7) v2(57.28,124.94) v2(57.28,124.18) v2(57.28,123.42) v2(57.43,40.23) v2(57.41,35.79) v2(57.88,93.98) v2(57.89,86.79) v2(58.17,126.47) v2(58.17,125.7) v2(58.17,124.94) v2(58.17,124.18) v2(58.17,123.42) v2(58.15,33.11) v2(58.37,95.66) v2(58.5,31.8) v2(58.88,30.45) v2(59.19,98.91) v2(59.53,100.23) v2(59.61,27.57) v2(59.77,101.26) v2(60.03,26.04) v2(61.06,26.04) v2(61.29,101.07) v2(62.46,41.48) v2(62.52,3.58) v2(62.52,2.82) v2(62.52,2.06) v2(62.52,1.3) v2(62.52,0.53) v2(62.64,100.69) v2(62.81,85.37) v2(63.4,3.58) v2(63.4,2.82) v2(63.4,2.06) v2(63.4,1.3) v2(63.4,0.53) v2(63.5,126.47) v2(63.5,125.7) v2(63.5,124.94) v2(63.5,124.18) v2(63.5,123.42) v2(64.29,3.58) v2(64.29,2.82) v2(64.29,2.06) v2(64.29,1.3) v2(64.29,0.53) v2(64.39,126.47) v2(64.39,125.7) v2(64.39,124.94) v2(64.39,124.18) v2(64.39,123.42) v2(64.77,26.97) v2(65.28,126.47) v2(65.28,125.7) v2(65.28,124.94) v2(65.28,124.18) v2(65.28,123.42) v2(66.43,27.45) v2(67.46,99.42) v2(67.59,42.92) v2(68,84.07) v2(68.53,99.01) v2(68.99,83.85) v2(69.17,43.32) v2(69.37,3.53) v2(69.37,2.77) v2(69.37,2.01) v2(69.37,1.24) v2(69.37,0.48) v2(69.65,41.96) v2(70.15,88.21) v2(70.19,39.87) v2(70.26,28.47) v2(70.26,3.53) v2(70.26,2.77) v2(70.26,2.01) v2(70.26,1.24) v2(70.26,0.48) v2(70.36,126.47) v2(70.36,125.7) v2(70.36,124.94) v2(70.36,124.18) v2(70.36,123.42) v2(70.57,89.9) v2(71.03,91.56) v2(71.09,36.32) v2(71.15,3.53) v2(71.15,2.77) v2(71.15,2.01) v2(71.15,1.24) v2(71.15,0.48) v2(71.25,126.47) v2(71.25,125.7) v2(71.25,124.94) v2(71.25,124.18) v2(71.25,123.42) v2(71.53,93.42) v2(71.63,98.31) v2(71.55,28.83) v2(72.14,126.47) v2(72.14,125.7) v2(72.14,124.94) v2(72.14,124.18) v2(72.14,123.42) v2(72.32,31.46) v2(72.35,96.57) v2(72.7,30.3) v2(72.84,97.95) v2(72.97,29.24) v2(76.49,3.53) v2(76.49,2.77) v2(76.49,2.01) v2(76.49,1.24) v2(76.49,0.48) v2(77.37,3.53) v2(77.37,2.77) v2(77.37,2.01) v2(77.37,1.24) v2(77.37,0.48) v2(77.47,126.47) v2(77.47,125.7) v2(77.47,124.94) v2(77.47,124.18) v2(77.47,123.42) v2(78.26,3.53) v2(78.26,2.77) v2(78.26,2.01) v2(78.26,1.24) v2(78.26,0.48) v2(78.36,126.47) v2(78.36,125.7) v2(78.36,124.94) v2(78.36,124.18) v2(78.36,123.42) v2(79.25,126.47) v2(79.25,125.7) v2(79.25,124.94) v2(79.25,124.18) v2(79.25,123.42) v2(82.19,20.94) v2(82.19,20.14) v2(82.99,22.54) v2(82.99,21.74) v2(82.99,20.94) v2(82.99,20.14) v2(83.79,22.54) v2(83.79,21.74) v2(83.79,20.94) v2(83.79,20.14) v2(84.59,22.54) v2(84.59,21.74) v2(84.59,20.94) v2(84.59,20.14) v2(91.44,126.44) v2(91.44,125.68) v2(91.44,124.92) v2(91.44,124.16) v2(91.44,123.39) v2(92.33,126.44) v2(92.33,125.68) v2(92.33,124.92) v2(92.33,124.16) v2(92.33,123.39) v2(93.22,126.44) v2(93.22,125.68) v2(93.22,124.92) v2(93.22,124.16) v2(93.22,123.39) v2(98.55,126.44) v2(98.55,125.68) v2(98.55,124.92) v2(98.55,124.16) v2(98.55,123.39) v2(99.44,126.44) v2(99.44,125.68) v2(99.44,124.92) v2(99.44,124.16) v2(99.44,123.39) v2(100.33,126.44) v2(100.33,125.68) v2(100.33,124.92) v2(100.33,124.16) v2(100.33,123.39) v2(115.54,11.94) v2(115.54,11.14) v2(115.54,10.34) v2(115.54,9.54) v2(116.34,11.94) v2(116.34,11.14) v2(116.34,10.34) v2(116.34,9.54) v2(117.14,11.94) v2(117.14,11.14) v2(117.14,10.34) v2(117.14,9.54) v2(117.88,24.97) v2(117.88,24.17) v2(117.88,23.37) v2(117.94,11.94) v2(117.94,11.14) v2(117.94,10.34) v2(117.94,9.54) v2(118.68,24.97) v2(118.68,24.17) v2(118.68,23.37) v2(118.68,22.57) v2(119.48,24.97) v2(119.48,24.17) v2(119.48,23.37) v2(119.48,22.57) v2(120.28,24.97) v2(120.28,24.17) v2(120.28,23.37) v2(120.28,22.57) v2(126.92,8.87) v2(126.92,8.07) v2(126.92,7.27) v2(126.92,6.47) v2(127.72,8.87) v2(127.72,8.07) v2(127.72,7.27) v2(127.72,6.47) v2(128.52,8.87) v2(128.52,8.07) v2(128.52,7.27) v2(129.2,24.87) v2(129.2,24.07) v2(129.2,23.27) v2(129.2,22.47) v2(129.32,8.87) v2(129.32,8.07) v2(129.32,7.27) v2(129.32,6.47) v2(130,24.87) v2(130,24.07) v2(130,23.27) v2(130,22.47) v2(130.8,24.87) v2(130.8,24.07) v2(130.8,23.27) v2(130.8,22.47) v2(131.6,24.87) v2(131.6,24.07) v2(131.6,23.27) v2(131.6,22.47) v2(146.76,28.96) v2(146.76,28.16) v2(146.76,27.36) v2(146.76,26.56) v2(147.55,28.96) v2(147.55,28.16) v2(147.55,27.36) v2(147.55,26.56) v2(148.36,28.96) v2(148.36,28.16) v2(148.36,27.36) v2(149.15,28.96) v2(149.15,28.16) v2(149.15,27.36) v2(149.15,26.56) v2(151.21,10.83) v2(151.21,9.83) v2(151.21,8.83) v2(152.21,10.83) v2(152.21,9.83) v2(152.21,8.83) v2(153.21,10.83) v2(153.21,8.83) v2(154.21,10.83) v2(154.21,9.83) v2(155.21,10.83) v2(165.22,31.48) v2(165.22,30.68) v2(165.22,29.88) v2(166.02,31.48) v2(166.02,30.68) v2(166.02,29.88) v2(166.82,31.48) v2(166.82,30.68) v2(166.82,29.88) v2(166.82,29.08) v2(167.62,31.48) v2(167.62,30.68) v2(167.62,29.88) v2(167.62,29.08) v2(176.9,31.22) v2(176.9,30.42) v2(176.9,28.82) v2(177.7,31.22) v2(177.7,30.42) v2(177.7,29.62) v2(177.7,28.82) v2(178.5,31.22) v2(178.5,30.42) v2(178.5,29.62) v2(178.5,28.82) v2(179.3,31.22) v2(179.3,30.42) v2(179.3,29.62) v2(179.3,28.82) v2(203.84,86.99) v2(203.84,85.72) v2(203.84,81.91) v2(203.84,78.11) v2(203.84,74.3) v2(203.84,70.48) v2(203.84,66.67) v2(203.84,62.86) v2(203.84,59.05) v2(203.84,55.24) v2(203.84,51.43) v2(203.84,47.62) v2(203.84,43.81) v2(203.84,40) v2(205.11,79.38) v2(205.11,75.56) v2(205.11,71.75) v2(205.11,67.94) v2(205.11,64.14) v2(205.11,60.32) v2(205.11,56.52) v2(205.11,52.7) v2(205.11,48.89) v2(205.11,45.08) v2(205.11,41.27) v2(205.11,38.73) v2(206.38,85.72) v2(206.38,78.11) v2(206.38,74.3) v2(206.38,70.48) v2(206.38,66.67) v2(206.38,62.86) v2(206.38,59.05) v2(206.38,55.24) v2(206.38,51.43) v2(206.38,47.62) v2(206.38,43.81) v2(206.38,40) v2(207.65,88.27) v2(207.65,84.45) v2(207.65,79.38) v2(207.65,75.56) v2(207.65,71.75) v2(207.65,67.94) v2(207.65,64.14) v2(207.65,60.32) v2(207.65,56.52) v2(207.65,52.7) v2(207.65,48.89) v2(207.65,45.08) v2(207.65,41.27) v2(207.65,38.73) v2(208.92,85.72) v2(208.92,78.11) v2(208.92,74.3) v2(208.92,70.48) v2(208.92,66.67) v2(208.92,62.86) v2(208.92,59.05) v2(208.92,55.24) v2(208.92,51.43) v2(208.92,47.62) v2(208.92,43.81) v2(208.92,40) v2(210.19,88.27) v2(210.19,79.38) v2(210.19,75.56) v2(210.19,71.75) v2(210.19,67.94) v2(210.19,64.14) v2(210.19,60.32) v2(210.19,56.52) v2(210.19,52.7) v2(210.19,48.89) v2(210.19,45.08) v2(210.19,41.27) v2(210.19,38.73) v2(211.46,86.99) v2(211.46,85.72) v2(211.46,76.83) v2(211.46,73.02) v2(211.46,69.22) v2(211.46,65.41) v2(211.46,61.59) v2(211.46,57.78) v2(211.46,53.97) v2(211.46,42.54) v2(211.46,40) v2(212.73,88.27) v2(212.73,74.3) v2(212.73,73.02) v2(212.73,69.22) v2(212.73,67.94) v2(212.73,64.14) v2(212.73,62.86) v2(212.73,59.05) v2(212.73,57.78) v2(212.73,53.97) v2(212.73,52.7) v2(212.73,48.89) v2(212.73,47.62) v2(212.73,43.81) v2(212.73,41.27) v2(212.73,38.73) v2(214,76.83) v2(214,75.56) v2(214,71.75) v2(214,70.48) v2(214,66.67) v2(214,65.41) v2(214,61.59) v2(214,60.32) v2(214,56.52) v2(214,55.24) v2(214,51.43) v2(214,50.16) v2(214,46.35) v2(214,45.08) v2(214,41.27) v2(214,40) v2(215.27,88.27) v2(215.27,84.45) v2(215.27,83.19) v2(215.27,79.38) v2(215.27,78.11) v2(215.27,74.3) v2(215.27,73.02) v2(215.27,69.22) v2(215.27,67.94) v2(215.27,64.14) v2(215.27,62.86) v2(215.27,59.05) v2(215.27,57.78) v2(215.27,53.97) v2(215.27,52.7) v2(215.27,48.89) v2(215.27,47.62) v2(215.27,43.81) v2(215.27,42.54) v2(215.27,38.73) v3(23.44,62.55) v3(25.22,63.26) v3(34.85,63.04) v3(34.85,61.62) v3(36.63,62.33) v3(37.54,54.61) v3(37.64,67.29) v3(37.57,59.6) v3(37.66,72.28) v3(38.23,54.61) v3(38.3,59.6) v3(38.39,72.29) v3(38.37,67.3) v3(39.22,51.92) v3(39.33,75.33) v3(39.85,52.27) v3(39.97,74.96) v3(41.71,47.57) v3(41.88,79.64) v3(42.32,47.9) v3(42.49,79.28) v3(62.36,53.79) v3(62.92,73.03) v3(63.12,53.79) v3(63.74,52.68) v3(64.25,53.19) v3(64.95,54.18) v3(65.58,54.18) v3(66.07,53.52) v3(66.78,53.52) v3(70.76,60.1) v3(71.19,60.54) v3(71.48,59.39) v3(71.91,59.82) v3(72.26,58.64) v3(72.69,59.07) v3(154.71,13.51) v3(154.71,12.9) v3(165.18,14.47) v3(165.18,13.96) v3(165.18,13.45) v3(165.18,12.88) v3(165.18,12.36) v3(165.18,11.86) v3(176.96,92.05) v3(176.95,91.4) v3(176.96,90.7) v3(178.59,110.52) v3(178.61,104.5) v3(178.92,99.34) v3(178.91,98.69) v3(178.92,97.99) v3(179.44,110.5) v3(179.44,104.5) v3(180.24,104.5) v3(180.29,110.49) v3(182.3,102.97) v3(182.31,102.12) v3(182.32,101.3) v3(189.84,111) v3(189.81,108.51) v3(189.84,105.99) v3(190.2,108.61) v3(190.69,111) v3(190.69,110) v3(190.69,104) v3(191.52,111) v3(191.49,110.01) v3(191.54,108.99) v3(191.52,104.01) v5(78.33,33.45) v5(78.31,29.64) v5(78.36,30.48) v5(79.68,33.45) v5(79.71,30.48) v5(79.65,29.64) v5(80.29,8.18) v5(80.31,7.26) v5(80.82,19) v5(81.64,8.18) v5(81.66,7.26) v5(82.63,33.4) v5(82.6,29.64) v5(82.65,30.48) v5(83.97,33.4) v5(84,30.48) v5(83.95,29.64) v5(85.24,26.75) v5(86.94,33.43) v5(86.92,29.67) v5(86.97,30.51) v5(87.68,21.62) v5(88.29,33.43) v5(88.32,30.51) v5(88.27,29.67) v5(88.87,5.38) v5(88.93,4.52) v5(89.66,5) v5(91.03,29.59) v5(91.08,33.45) v5(91.08,30.43) v5(91.69,104.98) v5(92.43,33.45) v5(92.43,30.43) v5(92.38,29.59) v5(93.62,11.99) v5(93.62,10.9) v5(93.88,14.81) v5(93.88,13.72) v5(93.98,22.68) v5(93.98,21.34) v5(94.13,6.65) v5(94.54,12.01) v5(94.54,10.9) v5(94.79,14.83) v5(94.79,13.72) v5(95.53,11.53) v5(95.66,33.43) v5(95.71,30.48) v5(95.68,29.54) v5(96.22,10.85) v5(96.75,11.54) v5(96.9,22.61) v5(96.9,21.26) v5(97,33.43) v5(97.03,29.54) v5(97.05,30.48) v5(97.41,10.85) v5(97.69,22.58) v5(97.69,21.23) v5(97.92,11.56) v5(98.45,18.01) v5(98.45,16.92) v5(98.45,10.87) v5(99.29,93.9) v5(99.29,90.86) v5(99.29,89.84) v5(99.36,18.03) v5(99.36,16.92) v5(100.3,92.89) v5(100.3,91.87) v5(100.3,90.86) v5(100.3,89.84) v5(100.3,88.82) v5(101.32,93.9) v5(101.32,92.89) v5(101.32,91.87) v5(101.32,90.86) v5(101.32,89.84) v5(101.32,88.82) v5(102.34,93.9) v5(102.34,92.89) v5(102.34,91.87) v5(102.34,90.86) v5(102.34,89.84) v5(102.34,88.82) v5(102.34,87.81) v5(103.35,93.9) v5(103.35,92.89) v5(103.35,91.87) v5(103.35,90.86) v5(103.35,89.84) v5(103.35,88.82) v5(103.35,87.81) v5(103.58,6.35) v5(103.58,5) v5(103.81,11.25) v5(103.81,9.91) v5(103.86,15.98) v5(103.86,14.63) v5(104.37,93.9) v5(104.37,92.89) v5(104.37,91.87) v5(104.37,90.86) v5(104.37,89.84) v5(104.37,88.82) v5(104.55,30.28) v5(104.55,28.93) v5(105.38,93.9) v5(105.38,91.87) v5(105.38,90.86) v5(105.38,89.84) v5(105.38,88.82) v5(106.25,21.56) v5(106.25,20.22) v5(106.55,6.43) v5(106.55,5.08) v5(106.81,15.85) v5(106.81,14.5) v5(106.81,11.2) v5(106.81,9.86) v5(107.34,6.43) v5(107.34,5.08) v5(107.37,30.33) v5(107.37,28.98) v5(107.59,15.85) v5(107.59,14.5) v5(107.59,11.2) v5(107.59,9.86) v5(108.15,30.33) v5(108.15,28.98) v5(109.22,21.69) v5(109.22,20.35) v5(110.01,21.69) v5(110.01,20.35) v5(111.4,12.73) v5(113.74,25.68) v5(114.1,35.48) v5(114.12,32.61) v5(114.07,31.8) v5(114.12,8.41) v5(115.44,35.48) v5(115.42,31.8) v5(115.47,32.61) v5(116.81,21.21) v5(119.02,21.44) v5(119.76,20.07) v5(122.76,26.92) v5(122.78,9.58) v5(123.04,19.38) v5(123.01,16.48) v5(123.01,15.7) v5(123.9,33.15) v5(123.88,32.38) v5(123.95,36.07) v5(124.38,19.38) v5(124.36,16.48) v5(124.36,15.7) v5(125.22,32.38) v5(125.15,26.97) v5(125.15,25.98) v5(125.3,36.07) v5(125.25,33.15) v5(131.6,37.97) v5(132.79,37.39) v5(132.77,34.47) v5(132.79,33.73) v5(132.89,15.04) v5(132.89,13.94) v5(134.14,37.39) v5(134.11,34.47) v5(134.14,33.73) v5(135.64,17.7) v5(135.69,19.96) v5(135.71,18.85) v5(135.66,16.59) v5(135.71,15.01) v5(135.71,13.92) v5(136.58,19.96) v5(136.6,18.87) v5(136.58,17.68) v5(136.6,16.59) v5(136.55,15.01) v5(136.55,13.89) v5(137.24,33.68) v5(137.26,37.44) v5(137.26,34.47) v5(138.61,37.44) v5(138.61,34.47) v5(138.58,33.68) v5(139.14,11.76) v5(139.14,10.95) v5(140.23,11.76) v5(140.23,10.97) v5(141.3,20.47) v5(141.35,24.13) v5(141.38,21.29) v5(142.44,24.13) v5(142.42,20.47) v5(142.52,31.06) v5(142.52,29.92) v5(142.47,21.29) v5(143.15,4.95) v5(143.21,3.91) v5(143.15,2.77) v5(143.41,12.85) v5(144.04,21.29) v5(143.97,20.47) v5(144.09,4.9) v5(144.09,3.86) v5(144.09,2.77) v5(144.35,12.85) v5(144.98,4.9) v5(145.01,3.89) v5(145.01,2.82) v5(145.14,21.29) v5(145.08,20.47) v5(145.49,8.08) v5(145.52,6.96) v5(145.57,25.43) v5(145.59,11.18) v5(145.57,10.31) v5(146.33,6.98) v5(146.35,8.05) v5(146.66,11.15) v5(146.69,10.34) v5(147.62,8.1) v5(147.6,7.04) v5(147.88,11.15) v5(147.85,10.29) v5(148.95,11.13) v5(148.97,10.31) v5(161.52,16.28) v5(161.52,15.47) v5(161.82,11.28) v5(161.82,10.49) v5(162.61,16.28) v5(162.61,15.49) v5(162.92,11.3) v5(162.92,10.49) v5(163.68,16.84) v5(163.7,15.72) v5(163.83,27.91) v5(164.03,10.72) v5(164.06,9.6) v5(164.54,16.81) v5(164.52,15.75) v5(164.87,10.69) v5(164.87,9.63) v5(167.89,35.36) v5(167.89,34.01) v5(168.17,36.45) v5(168.68,35.33) v5(168.68,33.99) v5(170.13,29.39) v5(170.23,25.96) v5(170.23,25.02) v5(170.99,25.96) v5(170.99,25.2) v5(171.09,29.39) v5(171.53,8.43) v5(171.53,7.34) v5(171.81,11.43) v5(172.09,29.41) v5(172.36,8.46) v5(172.36,7.34) v5(174.27,5.21) v5(174.32,4.17) v5(174.27,3.02) v5(174.4,9.75) v5(174.4,8.81) v5(174.45,7.9) v5(175.21,5.16) v5(175.21,4.11) v5(175.21,3.02) v5(175.54,9.7) v5(175.49,8.81) v5(175.51,7.9) v5(176.1,5.16) v5(176.12,4.14) v5(176.12,3.07) v5(176.53,8.81) v5(176.53,7.92) v5(176.58,9.75) v5(178.89,10.77) v5(178.87,9.98) v5(178.99,35.15) v5(178.99,33.81) v5(179.25,36.2) v5(179.78,35.13) v5(179.78,33.78) v5(179.96,10.77) v5(179.96,9.98) v5(181.69,11.46) v5(181.74,10.67) v5(181.89,25.63) v5(181.89,24.61) v5(182.09,29.72) v5(182.25,16.64) v5(182.25,15.49) v5(182.3,11.07) v5(182.68,24.74) v5(182.83,10.67) v5(182.88,25.5) v5(182.93,11.48) v5(183.06,29.72) v5(183.26,16.64) v5(183.26,15.49) v5(184.05,29.74) v5(184.18,17.5) v5(185.06,17.5) v6(12.6,60.81) v6(12.63,58.54) v6(13.29,68.16) v6(13.29,66.16) v6(13.51,61.77) v6(13.53,57.44) v6(14.19,69.26) v6(14.19,65.06) v6(15.73,57.34) v6(15.85,61.7) v6(16.34,46.23) v6(16.39,69.36) v6(16.39,64.96) v6(16.48,44.82) v6(16.93,61.44) v6(16.93,57.64) v6(17.59,69.06) v6(17.59,65.26) v6(17.83,47.86) v6(17.9,43.41) v6(18.89,48.5) v6(19.31,43.27) v6(20.94,44.75) v6(21.57,45.81) v6(25.99,34.78) v6(26.13,33.37) v6(27.48,36.41) v6(27.55,31.95) v6(28.54,37.04) v6(28.96,31.81) v6(30.59,33.29) v6(31.23,34.36) v6(83.27,93.99) v6(83.27,91.99) v6(83.58,86.58) v6(83.58,84.58) v6(84.17,95.09) v6(84.17,90.89) v6(84.48,87.68) v6(84.48,83.48) v6(86.37,95.19) v6(86.37,90.79) v6(86.68,87.78) v6(86.68,83.38) v6(87.57,94.89) v6(87.57,91.09) v6(87.88,87.48) v6(87.88,83.68) v6(90.51,98.19) v6(90.61,100.39) v6(90.81,96.99) v6(90.84,81.01) v6(90.94,78.81) v6(91.14,82.21) v6(91.71,101.29) v6(92.04,77.91) v6(93.71,101.29) v6(94.04,77.91) v6(94.61,96.99) v6(94.81,100.39) v6(94.91,98.19) v6(94.94,82.21) v6(95.14,78.81) v6(95.24,81.01) v6(101.2,78.07) v6(101.3,75.87) v6(101.5,79.27) v6(102.4,74.97) v6(104.4,74.97) v6(105.3,79.27) v6(105.5,75.87) v6(105.6,78.07)
